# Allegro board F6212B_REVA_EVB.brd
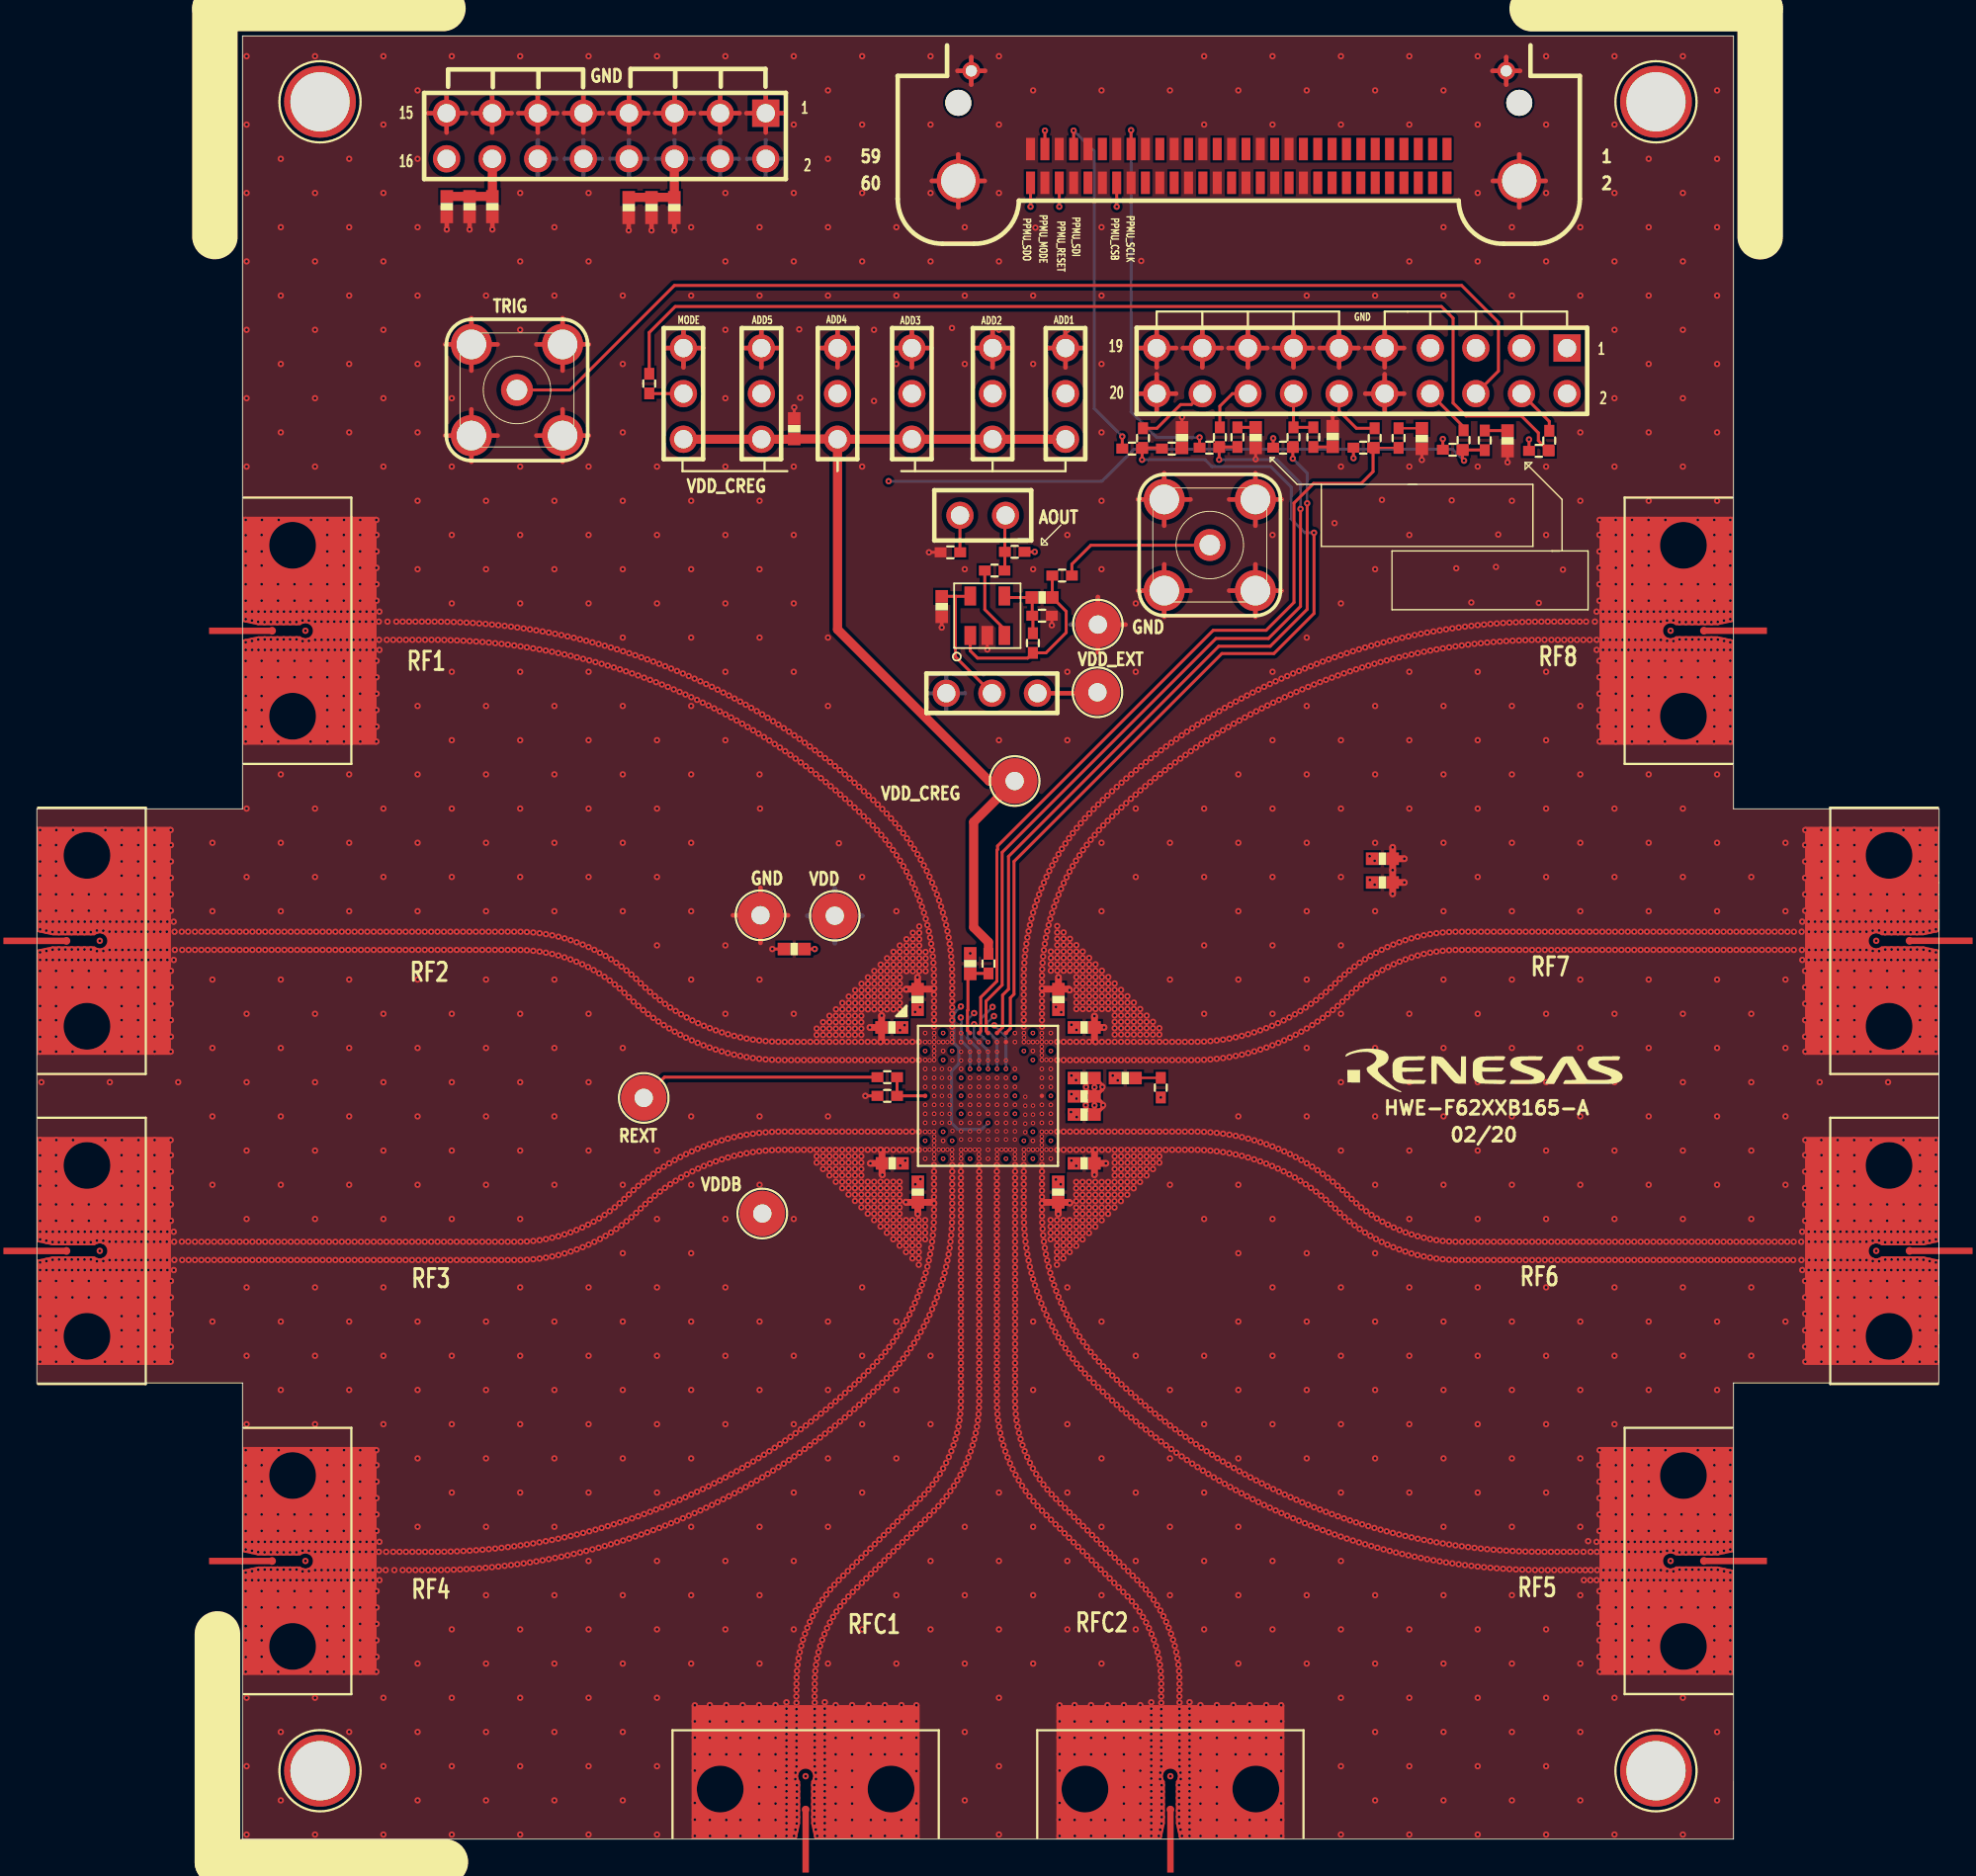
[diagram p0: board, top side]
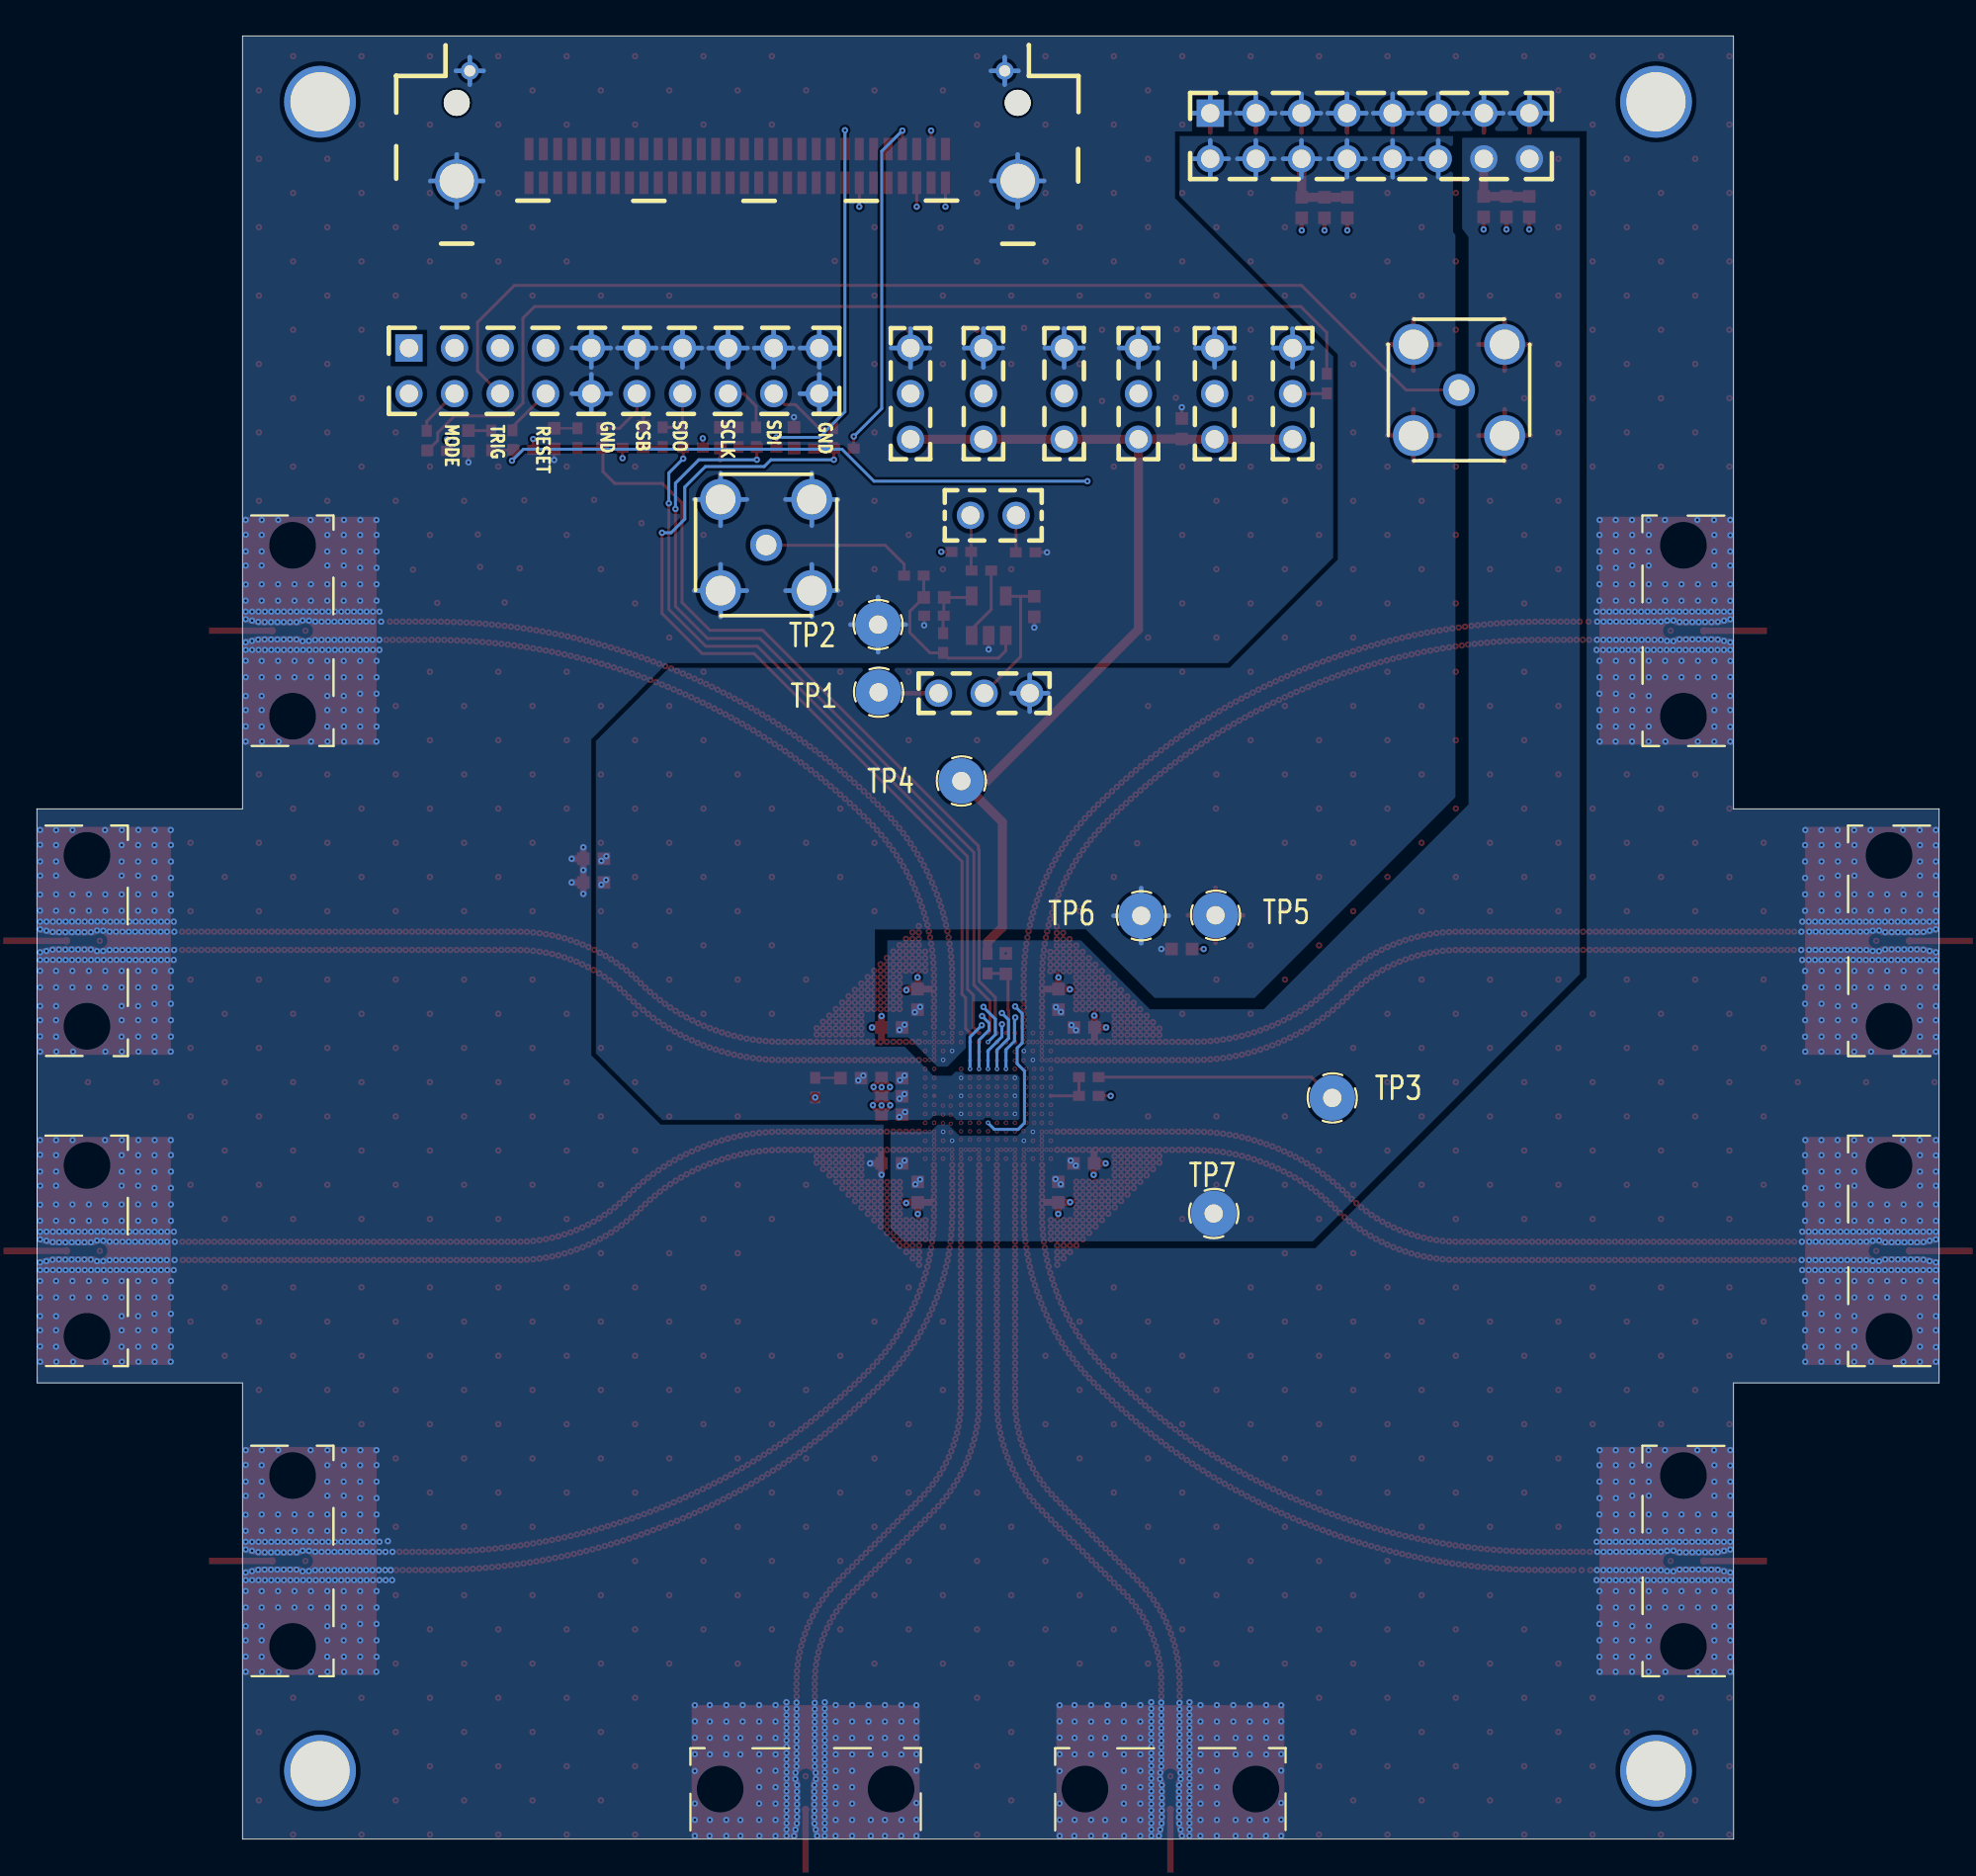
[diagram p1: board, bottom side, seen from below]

Outline 105.97 x 100.44 mm; copper layers: TOP, L2, L3, BOTTOM. Coordinates in mm from the lower left corner of the outline.
Outline path: 0,57.39 11.46,57.39 11.46,100.44 94.51,100.44 94.51,57.39 105.97,57.39 105.95,25.41 94.51,25.41 94.51,0 11.45,0 11.46,25.41 0,25.41 0,57.39

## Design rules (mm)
constraint set DEFAULT: min track width 0.203
net group CREG: nets CREG VDD_CREG
net group N411943: nets N411943 N412142
net group AOUT: nets AOUT N421198 N4197900
net group CSB: nets CSB F2232H_CSB N724495 PPMU_CSB
net group F2232H_MODE: nets F2232H_MODE MODE N417748 PPMU_MODE
net group F2232H_RESET: nets F2232H_RESET N739084 PPMU_RESET RESET
net group F2232H_SCLK: nets F2232H_SCLK N719451 PPMU_SCLK SCLK
net group F2232H_SDI: nets F2232H_SDI N716555 PPMU_SDI SDI
net group N422340: nets N422340 N422374 N4219901
net group PPMU_SDO: nets N485360 N722947 PPMU_SDO SDO
net group RF: nets RF1 RF2 RF3 RF4 RF5 RF6 RF7 RF8
net group VDD: nets N575389

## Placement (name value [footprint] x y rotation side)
C1  10uF  [CAPC1005N]  35.51 90.88 90 top
C3  DNI_C0402  [CAPC1005N]  32.97 90.88 90 top
C4  1uF  [CAPC1005N]  34.24 90.88 90 top
C5  100pF  [CAPC1005N]  58.34 41.38 180 top
C6  100pF  [CAPC1005N]  58.34 42.39 180 top
C7  0.1uF  [CAPC1005N]  42.19 49.58 0 top
C8  1uF  [CAPC1005N]  42.19 78.56 270 top
C9  1uF  [CAPC1005N]  51.99 48.77 90 top
C10  10uF  [CAPC1005N]  50.41 68.66 90 top
C12  DNI_C0402  [CAPC1005N]  81.93 77.89 90 top
C13  DNI_C0402  [CAPC1005N]  55.99 69.16 180 top
C14  DNI_C0402  [CAPC1005N]  77.15 78.02 90 top
C15  DNI_C0402  [CAPC1005N]  67.89 78.07 90 top
C16  DNI_C0402  [CAPC1005N]  63.79 78.07 270 top
C17  DNI_C0402  [CAPC1005N]  72.19 78.13 270 top
C18  0.018uF  [CAPC1005N]  74.96 53.29 180 top
C19  3900pF  [CAPC1005N]  74.96 54.61 180 top
C20  0.068uF  [CAPC1005N]  60.63 42.39 180 top
C21  10uF  [CAPC1005N]  22.83 90.93 90 top
C22  1uF  [CAPC1005N]  24.1 90.93 90 top
C23  DNI_C0402  [CAPC1005N]  25.37 90.93 90 top
C24  100pF  [CAPC1005N]  58.34 40.36 180 top
C25  0.1uF  [CAPC1005N]  58.34 37.64 180 top
C26  0.018uF  [CAPC1005N]  56.9 36.04 90 top
C27  3900pF  [CAPC1005N]  49.07 36.04 90 top
C28  100pF  [CAPC1005N]  47.65 37.64 0 top
C29  0.018uF  [CAPC1005N]  49.06 46.77 270 top
C30  3900pF  [CAPC1005N]  56.91 46.77 270 top
C31  0.1uF  [CAPC1005N]  47.62 45.21 0 top
C32  100pF  [CAPC1005N]  58.34 45.21 180 top
FID1  Fiducial  [FIDUCIAL]  96 101.96 0 top
FID2  Fiducial  [FIDUCIAL]  10.06 -1.27 180 top
FID3  Fiducial  [FIDUCIAL]  9.92 101.97 90 top
J1  ELF40-002 F6212  [ELF40-002_F6121_PIN1_NOANTIPAD]  11.46 67.31 270 top
J2  ELF40-002 F6212  [ELF40-002_F6121_PIN1_NOANTIPAD]  0 50.04 270 top
J3  ELF40-002 F6212  [ELF40-002_F6121_PIN1_NOANTIPAD]  0 32.77 270 top
J4  ELF40-002 F6212  [ELF40-002_F6121_PIN1_NOANTIPAD]  11.46 15.49 270 top
J5  ELF40-002 F6212  [ELF40-002_F6121_PIN1_NOANTIPAD]  42.82 0 0 top
J10  ELF40-002 F6212  [ELF40-002_F6121_PIN1_NOANTIPAD]  63.14 0 0 top
J11  Headerstrip 1X3  [HEADER_1X3_VERTICAL]  57.3 80.52 270 top
J12  Headerstrip 1X3  [HEADER_1X3_VERTICAL]  53.24 80.52 90 top
J13  Headerstrip 1X3  [HEADER_1X3_VERTICAL]  48.74 80.52 90 top
J14  Headerstrip 1X3  [HEADER_1X3_VERTICAL]  44.6 80.52 90 top
J15  Headerstrip 1X3  [HEADER_1X3_VERTICAL]  40.36 80.52 270 top
J16  Headerstrip 2X8  [HEADER_2X8]  29.17 94.87 180 top
J17  ELF40-002 F6212  [ELF40-002_F6121_PIN1_NOANTIPAD]  94.51 15.49 90 top
J18  ELF40-002 F6212  [ELF40-002_F6121_PIN1_NOANTIPAD]  105.97 32.77 90 top
J19  ELF40-002 F6212  [ELF40-002_F6121_PIN1_NOANTIPAD]  105.97 50.04 90 top
J20  ELF40-002 F6212  [ELF40-002_F6121_PIN1_NOANTIPAD]  94.51 67.31 90 top
J21  TE: 1-1337482-0  [SMA_VERT_SNAP_ON-5]  65.34 72.09 0 top
J22  Headerstrip 2X10  [HEADER_2X10]  73.81 81.79 180 top
J26  Headerstrip 1X2  [HEADER_1X2_VERTICAL]  52.69 73.74 180 top
J28  Headerstrip 1X3  [HEADER_1X3_VERTICAL]  36.02 80.52 270 top
J29  Headerstrip 1X3  [HEADER_1X3_VERTICAL]  53.2 63.83 180 top
J30  TE: 1-1337482-0  [SMA_VERT_SNAP_ON-5]  26.75 80.72 0 top
NOREF  -  []  94.51 0 90 top
NOREF#2  -  []  72.54 41.4 0 top
NOREF#3  -  []  105.95 25.41 90 top
NOREF#4  -  []  11.46 100.44 0 top
NOREF#5  -  []  0 57.39 0 top
NOREF#6  -  []  -204.75 -215.7 0 top
R1  DNI_R0402  [RESC1005N]  47.37 41.4 180 top
R2  DNI_R0402  [RESC1005N]  47.37 42.44 180 top
R3  DNI_R0402  [RESC1005N]  34.11 81.08 270 top
R4  0  [RESC1005N]  54.47 71.7 0 top
R5  DNI_R0402  [RESC1005N]  50.89 71.68 0 top
R6  0  [RESC1005N]  55.49 66.62 90 top
R7  DNI_R0402  [RESC1005N]  55.99 68.15 0 top
R9  62  [RESC1005N]  57.11 70.38 180 top
R10  0  [RESC1005N]  79.48 77.93 270 top
R11  DNI_R0402  [RESC1005N]  80.66 77.91 270 top
R12  0  [RESC1005N]  74.52 78.04 270 top
R13  DNI_R0402  [RESC1005N]  75.86 78.04 270 top
R14  0  [RESC1005N]  65.9 78.09 270 top
R15  DNI_R0402  [RESC1005N]  66.88 78.09 270 top
R16  0  [RESC1005N]  61.62 78.04 270 top
R17  DNI_R0402  [RESC1005N]  63.22 77.46 180 top
R18  0  [RESC1005N]  70 78.09 270 top
R19  DNI_R0402  [RESC1005N]  71.11 78.09 90 top
R20  DNI_R0402  [RESC1005N]  53.01 48.77 90 top
R25  0  [RESC1005N]  53.35 70.66 0 top
R26  0  [RESC1005N]  62.61 41.86 90 top
R27  DNI_R0402  [RESC1005N]  61.01 77.46 0 top
R28  DNI_R0402  [RESC1005N]  65.32 77.51 0 top
R29  DNI_R0402  [RESC1005N]  69.42 77.51 0 top
R30  DNI_R0402  [RESC1005N]  73.89 77.51 0 top
R31  DNI_R0402  [RESC1005N]  83.67 77.33 0 top
R32  0  [RESC1005N]  84.25 77.9 270 top
R33  DNI_R0402  [RESC1005N]  78.87 77.39 0 top
SO1  Standoff 25mm  [MH320]  15.77 96.77 0 top
SO2  Standoff 25mm  [MH320]  90.2 96.77 0 top
SO3  Standoff 25mm  [MH320]  15.77 3.81 0 top
SO4  Standoff 25mm  [MH320]  90.2 3.81 0 top
TP1  Loop  [TP254_102]  59.08 63.88 0 top
TP2  Loop  [TP254_102]  59.11 67.65 0 top
TP3  Loop  [TP254_102]  33.81 41.29 0 top
TP4  Loop  [TP254_102]  54.47 58.94 0 top
TP5  Loop  [TP254_102]  40.31 51.46 0 top
TP6  Loop  [TP254_102]  44.45 51.44 0 top
TP7  Loop  [TP254_102]  40.41 34.85 0 top
U2  OPA356  [SOT23-5_TI]  52.95 68.15 0 top
U3  F6212  [BGA165_50P_7X7]  52.98 41.4 0 top
U4  Connector 60P  [SAMTEC_EFR8-60N]  66.95 100.42 0 top

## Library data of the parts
C1 C3-C10 C12-C32 = CAP_1005N: alternate symbols: (CAPC1005L,CAPC1005RF)
FID1-FID3 = Fiducial
J1-J5 J10 J17-J20 = SMA_EDGE_ELF40
J11-J15 J28 J29 = HEADER_1X3
J16 = HEADER_2x8_ALT
J21 J30 = SMA_VERT_SNAPON
J22 = HEADER_2X10
J26 = HEADER_1X2
R1-R7 R9-R20 R25-R33 = RESISTOR_1005N: alternate symbols: (RESC1005RF,RESC1005L,RESC1005M)
SO1-SO4 = Standoff
TP1-TP7 = TESTPOINT
U2 = OPA356
U3 = F6212
U4 = Samtec Female Edge

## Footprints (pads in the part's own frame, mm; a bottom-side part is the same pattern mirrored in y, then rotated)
BGA165_50P_7X7
  round 0.25 smd: A1(-3.5,3.5) A2(-3,3.5) A3(-2.5,3.5) A4(-2,3.5) A5(-1.5,3.5) A6(-1,3.5) A7(-0.5,3.5) A8(0,3.5) A9(0.5,3.5) A10(1,3.5) A11(1.5,3.5) A12(2,3.5) A13(2.5,3.5) A14(3,3.5) A15(3.5,3.5) B1(-3.5,3) B2(-3,3) B3(-2.5,3) B4(-2,3) B5(-1.5,3) B6(-1,3) B7(-0.5,3) B8(0,3) B9(0.5,3) B10(1,3) B11(1.5,3) B12(2,3) B13(2.5,3) B14(3,3) B15(3.5,3) C1(-3.5,2.5) C2(-3,2.5) C3(-2.5,2.5) C4(-2,2.5) C12(2,2.5) C13(2.5,2.5) C14(3,2.5) C15(3.5,2.5) D1(-3.5,2) D2(-3,2) D3(-2.5,2) D13(2.5,2) D14(3,2) D15(3.5,2) E1(-3.5,1.5) E2(-3,1.5) E5(-1.5,1.5) E6(-1,1.5) E7(-0.5,1.5) E8(0,1.5) E9(0.5,1.5) E10(1,1.5) E11(1.5,1.5) E14(3,1.5) E15(3.5,1.5) F1(-3.5,1) F2(-3,1) F5(-1.5,1) F6(-1,1) F7(-0.5,1) F8(0,1) F9(0.5,1) F10(1,1) F11(1.5,1) F14(3,1) F15(3.5,1) G1(-3.5,0.5) G2(-3,0.5) G5(-1.5,0.5) G6(-1,0.5) G7(-0.5,0.5) G8(0,0.5) G9(0.5,0.5) G10(1,0.5) G11(1.5,0.5) G14(3,0.5) G15(3.5,0.5) H1(-3.5,0) H2(-3,0) H5(-1.5,0) H6(-1,0) H7(-0.5,0) H8(0,0) H9(0.5,0) H10(1,0) H11(1.5,0) H14(3,0) H15(3.5,0) J1(-3.5,-0.5) J2(-3,-0.5) J5(-1.5,-0.5) J6(-1,-0.5) J7(-0.5,-0.5) J8(0,-0.5) J9(0.5,-0.5) J10(1,-0.5) J11(1.5,-0.5) J14(3,-0.5) J15(3.5,-0.5) K1(-3.5,-1) K2(-3,-1) K5(-1.5,-1) K6(-1,-1) K7(-0.5,-1) K8(0,-1) K9(0.5,-1) K10(1,-1) K11(1.5,-1) K14(3,-1) K15(3.5,-1) L1(-3.5,-1.5) L2(-3,-1.5) L5(-1.5,-1.5) L6(-1,-1.5) L7(-0.5,-1.5) L8(0,-1.5) L9(0.5,-1.5) L10(1,-1.5) L11(1.5,-1.5) L14(3,-1.5) L15(3.5,-1.5) M1(-3.5,-2) M2(-3,-2) M3(-2.5,-2) M13(2.5,-2) M14(3,-2) M15(3.5,-2) N1(-3.5,-2.5) N2(-3,-2.5) N3(-2.5,-2.5) N4(-2,-2.5) N12(2,-2.5) N13(2.5,-2.5) N14(3,-2.5) N15(3.5,-2.5) P1(-3.5,-3) P2(-3,-3) P3(-2.5,-3) P4(-2,-3) P5(-1.5,-3) P6(-1,-3) P7(-0.5,-3) P8(0,-3) P9(0.5,-3) P10(1,-3) P11(1.5,-3) P12(2,-3) P13(2.5,-3) P14(3,-3) P15(3.5,-3) Q1(-3.5,-3.5) Q2(-3,-3.5) Q3(-2.5,-3.5) Q4(-2,-3.5) Q5(-1.5,-3.5) Q6(-1,-3.5) Q7(-0.5,-3.5) Q8(0,-3.5) Q9(0.5,-3.5) Q10(1,-3.5) Q11(1.5,-3.5) Q12(2,-3.5) Q13(2.5,-3.5) Q14(3,-3.5) Q15(3.5,-3.5)
CAPC1005N
  rect 0.7x0.7 smd: 1(-0.572,0) 2(0.572,0)
ELF40-002_F6121_PIN1_NOANTIPAD
  round 0 hole 2.032 unplated: (-4.76,2.79) (4.76,2.79)
  custom 0.107x0.107 smd: 1(0.002,0)
  rect 0.15x6 smd: 2(3.25,3) 3(-3.25,3)
HEADER_1X2_VERTICAL
  round 1.52 hole 1.02: 1(-1.27,0) 2(1.27,0)
HEADER_1X3_VERTICAL
  round 1.52 hole 1.02: 1(-2.54,0) 2(0,0) 3(2.54,0)
HEADER_2X8
  rect 1.52x1.52 hole 1.02: 1(-11.43,-1.27)
  round 1.52 hole 1.02: 2(-11.43,1.27) 3(-8.89,-1.27) 4(-8.89,1.27) 5(-6.35,-1.27) 6(-6.35,1.27) 7(-3.81,-1.27) 8(-3.81,1.27) 9(-1.27,-1.27) 10(-1.27,1.27) 11(1.27,-1.27) 12(1.27,1.27) 13(3.81,-1.27) 14(3.81,1.27) 15(6.35,-1.27) 16(6.35,1.27)
HEADER_2X10
  rect 1.52x1.52 hole 1.02: 1(-11.43,-1.27)
  round 1.52 hole 1.02: 2(-11.43,1.27) 3(-8.89,-1.27) 4(-8.89,1.27) 5(-6.35,-1.27) 6(-6.35,1.27) 7(-3.81,-1.27) 8(-3.81,1.27) 9(-1.27,-1.27) 10(-1.27,1.27) 11(1.27,-1.27) 12(1.27,1.27) 13(3.81,-1.27) 14(3.81,1.27) 15(6.35,-1.27) 16(6.35,1.27) 17(8.89,-1.27) 18(8.89,1.27) 19(11.43,-1.27) 20(11.43,1.27)
MH320
  round 4 hole 3.3: (0,0)
RESC1005N
  rect 0.66x0.56 smd: 1(-0.546,0) 2(0.546,0)
SAMTEC_EFR8-60N
  round 1.45 hole 1.45 unplated: (-15.625,-3.7) (15.625,-3.7)
  rect 0.5x1.25 smd: 1(11.6,-6.275) 2(11.6,-8.155) 3(10.8,-6.275) 4(10.8,-8.155) 5(10,-6.275) 6(10,-8.155) 7(9.2,-6.275) 8(9.2,-8.155) 9(8.4,-6.275) 10(8.4,-8.155) 11(7.6,-6.275) 12(7.6,-8.155) 13(6.8,-6.275) 14(6.8,-8.155) 15(6,-6.275) 16(6,-8.155) 17(5.2,-6.275) 18(5.2,-8.155) 19(4.4,-6.275) 20(4.4,-8.155) 21(3.6,-6.275) 22(3.6,-8.155) 23(2.8,-6.275) 24(2.8,-8.155) 25(2,-6.275) 26(2,-8.155) 27(1.2,-6.275) 28(1.2,-8.155) 29(0.4,-6.275) 30(0.4,-8.155) 31(-0.4,-6.275) 32(-0.4,-8.155) 33(-1.2,-6.275) 34(-1.2,-8.155) 35(-2,-6.275) 36(-2,-8.155) 37(-2.8,-6.275) 38(-2.8,-8.155) 39(-3.6,-6.275) 40(-3.6,-8.155) 41(-4.4,-6.275) 42(-4.4,-8.155) 43(-5.2,-6.275) 44(-5.2,-8.155) 45(-6,-6.275) 46(-6,-8.155) 47(-6.8,-6.275) 48(-6.8,-8.155) 49(-7.6,-6.275) 50(-7.6,-8.155) 51(-8.4,-6.275) 52(-8.4,-8.155) 53(-9.2,-6.275) 54(-9.2,-8.155) 55(-10,-6.275) 56(-10,-8.155) 57(-10.8,-6.275) 58(-10.8,-8.155) 59(-11.6,-6.275) 60(-11.6,-8.155)
  round 1 hole 0.63: G1(14.9,-1.92) G3(-14.9,-1.92)
  round 2.41 hole 1.91: G2(15.625,-8.05) G4(-15.625,-8.05)
SMA_VERT_SNAP_ON-5
  round 1.778 hole 1.143: 1(0,0)
  round 2.286 hole 1.651: 2(-2.54,2.54) 3(2.54,2.54) 4(2.54,-2.54) 5(-2.54,-2.54)
SOT23-5_TI
  rect 0.65x1.06 smd: 1(-0.95,-1.1) 2(0,-1.1) 3(0.95,-1.1) 4(0.95,1.1) 5(-0.95,1.1)
TP254_102
  round 2.54 hole 1.02: 1(0,0)

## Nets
GND: C1.1 C3.1 C4.1 C5.1 C6.1 C7.1 C8.1 C9.2(\B\) C10.1 C12.1 C14.1 C15.1 C16.1 C17.1 C18.1 C19.1 C21.1 C22.1 C23.1 C24.1 C25.1 C26.1 C27.1 C28.1 C29.1 C30.1 C31.1 C32.1 J1.2 J1.3 J2.2 J2.3 J3.2 J3.3 J4.2 J4.3 J5.2 J5.3 J10.2 J10.3 J11.1 J12.3 J13.3 J14.3 J15.1 J16.1 J16.3 J16.5 J16.7 J16.9 J16.11 J16.13 J16.15 J17.2 J17.3 J18.2 J18.3 J19.2 J19.3 J20.2 J20.3 J21.2 J21.3 J21.4 J21.5 J22.9 J22.10 J22.11 J22.13 J22.15 J22.17 J22.19 J22.20 J28.1 J30.2 J30.3 J30.4 J30.5 R1.2 R5.1 R7.2 R26.1 TP2.1 TP5.1 U2.2(\V-\) U3.A1 U3.A2 U3.A4 U3.A5 U3.A11 U3.A12 U3.A14 U3.A15 U3.B1 U3.B2 U3.B3 U3.B4 U3.B5 U3.B6 U3.B7 U3.B9 U3.B10 U3.B11 U3.B12 U3.B13 U3.B14 U3.B15 U3.C2 U3.C3 U3.C13 U3.C14 U3.D1 U3.D2 U3.D14 U3.D15 U3.E1 U3.E2 U3.E5 U3.E11 U3.E14 U3.E15 U3.F1 U3.F2 U3.F6 U3.F7 U3.F8 U3.F9 U3.F10 U3.F14 U3.F15 U3.G1 U3.G2 U3.G5 U3.G6 U3.G7 U3.G8 U3.G9 U3.G10 U3.G11 U3.G14 U3.G15 U3.H2 U3.H6 U3.H7 U3.H8 U3.H9 U3.H10 U3.H14 U3.J1 U3.J2 U3.J5 U3.J6 U3.J7 U3.J8 U3.J9 U3.J10 U3.J11 U3.J14 U3.J15 U3.K1 U3.K2 U3.K6 U3.K7 U3.K8 U3.K9 U3.K10 U3.K14 U3.K15 U3.L1 U3.L2 U3.L5 U3.L6 U3.L7 U3.L9 U3.L10 U3.L11 U3.L14 U3.L15 U3.M1 U3.M2 U3.M14 U3.M15 U3.N2 U3.N3 U3.N13 U3.N14 U3.P1 U3.P2 U3.P3 U3.P4 U3.P5 U3.P6 U3.P7 U3.P8 U3.P9 U3.P10 U3.P11 U3.P12 U3.P13 U3.P14 U3.P15 U3.Q1 U3.Q2 U3.Q4 U3.Q5 U3.Q7 U3.Q8 U3.Q9 U3.Q11 U3.Q12 U3.Q14 U3.Q15 U4.22 U4.23 U4.26 U4.27 U4.30 U4.31 U4.34 U4.35 U4.38 U4.39 U4.42 U4.43 U4.46 U4.47 U4.50 U4.51 U4.54 U4.55 U4.58 U4.59 U4.G1 U4.G2 U4.G3 U4.G4
VDD: C1.2(\B\) C3.2(\B\) C4.2(\B\) C5.2(\B\) C6.2(\B\) C7.2(\B\) C18.2(\B\) C19.2(\B\) C20.2(\B\) C24.2(\B\) J16.2 J16.4 J16.6 J16.8 J16.10 J16.12 J29.3 TP6.1 U3.F5 U3.F11 U3.H5 U3.H11 U3.K5(\VDD_K5\) U3.K11
VDD_CREG: C8.2(\B\) J11.3 J12.1 J13.1 J14.1 J15.3 J28.3 R20.2 TP4.1
VDD_EXT: J29.1 TP1.1
VDDB: C21.2(\B\) C22.2(\B\) C23.2(\B\) C25.2(\B\) C26.2(\B\) C27.2(\B\) C28.2(\B\) C29.2(\B\) C30.2(\B\) C31.2(\B\) C32.2(\B\) J16.14 J16.16 TP7.1 U3.C4 U3.C12 U3.D3 U3.D13 U3.M3 U3.M13 U3.N4 U3.N12
ADD1: J11.2 U3.E10
ADD2: J12.2 U3.E9
ADD3: J13.2 U3.E8
ADD4: J14.2 U3.E7
ADD5: J15.2 U3.E6
AOUT: R4.2 U3.H15
CREG: C9.1 R20.1 U3.A6
CSB: R12.2 R13.2 R30.2 U3.A7
F2232H_CSB: J22.12 R12.1
F2232H_MODE: J22.4 R32.1
F2232H_RESET: J22.8 R10.1
F2232H_SCLK: J22.16 R14.1
F2232H_SDI: J22.18 R16.1
MODE: R3.1 R31.2 R32.2
PPMU_CSB: R30.1 U4.48
PPMU_MODE: R31.1 U4.57
PPMU_RESET: R33.1 U4.56
PPMU_SCLK: R28.1 U4.45
PPMU_SDI: R27.1 U4.53
PPMU_SDO: R29.1 U4.60
RESET: R10.2 R11.2 R33.2 U3.B8
RF1: J1.1 U3.A3
RF2: J2.1 U3.C1
RF3: J3.1 U3.N1
RF4: J4.1 U3.Q3
RF5: J17.1 U3.Q13
RF6: J18.1 U3.N15
RF7: J19.1 U3.C15
RF8: J20.1 U3.A13
RFC1: J5.1 U3.Q6
RFC2: J10.1 U3.Q10
SCLK: R14.2 R15.2 R28.2 U3.A8
SDI: R16.2 R17.2 R27.2 U3.A10
SDO: R18.2 R29.2 U3.A9
TRIG: J22.6 J30.1(\S1\)
N411943: R1.1 R2.1 U3.H1
N412142: R2.2 TP3.1
N417748: J28.2 R3.2 U3.L8
N421198: J26.1 R4.1 R25.2
N421279: J26.2 R5.2
N422340: C13.2(\B\) R6.2 R7.1 U2.4
N422374: C13.1 R6.1 R9.2 U2.1
N464793: C10.2(\B\) J29.2 U2.5
N485360: J22.14 R18.1 R19.2
N575389: C20.1 R26.2
N716555: C16.2(\B\) R17.1
N719451: C15.2(\B\) R15.1
N722947: C17.2(\B\) R19.1
N724495: C14.2(\B\) R13.1
N739084: C12.2(\B\) R11.1
N4197900: R25.1 U2.3
N4219901: J21.1(\S1\) R9.1

Pads without a net: J22 1 2 3 5 7; U4 1 2 3 4 5 6 7 8 9 10 11 12 13 14 15 16 17 18 19 20 21 24 25 28 29 32 33 36 37 40 41 44 49 52

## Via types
v1: diameter 0.356, hole 0.152, TOP to BOTTOM, 1868 vias
v2: diameter 0.25, hole 0.13, TOP to BOTTOM, 21 vias
v3: diameter 0.25, hole 0.13, TOP to L2, 11 vias
v4: diameter 0.356, hole 0.152, TOP to L2, 10 vias
v5: diameter 0.356, hole 0.152, TOP to L3, 3542 vias
v6: diameter 0.25, hole 0.13, TOP to L3, 214 vias

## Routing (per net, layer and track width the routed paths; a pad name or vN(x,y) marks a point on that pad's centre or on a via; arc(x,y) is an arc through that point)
GND: length 680.7
  TOP w0.127: U3.G14 v6(55.98,41.9) ; U3.M2 v6(49.98,39.41)
  TOP w0.165: C16.1 v1(63.79,79.21) ; v1(59.4,40.88) 59.4,40.96 ; C15.1 v5(67.89,76.86) ; C7.1 v1(40.97,49.58) ; R1.2 v1(46.15,41.4) ; C8.1 v1(42.19,79.76) ; C14.1 v1(77.15,76.82) ; v1(47.07,45.87) 47.07,45.22 C31.1 ; R5.1 v1(49.7,71.68) ; C12.1 v1(81.93,76.7) ; R7.2 v1(56.54,67.61) ; v1(59.36,41.9) 59.36,42.01 58.98,42.39 C6.1 58.85,42.39 58.45,41.99 v1(58.45,41.9) ; C24.1 v1(58.92,40.87) ; U2.2 v1(52.95,66.27)
  TOP w0.203: C10.1 v1(50.41,67.49) ; v1(58.45,41.9) 58.45,41.78 58.85,41.38 ; v1(59.4,40.88) 59.4,40.78 58.98,40.36 C24.1 58.85,40.36 58.43,40.78 v1(58.43,40.88) 58.43,40.96 58.85,41.38 ; 58.85,41.38 C5.1 ; 59.4,40.96 58.98,41.38 ; 58.98,41.38 C5.1 ; 58.98,41.38 59.36,41.76 v1(59.36,41.9) ; C5.1 v1(58.92,41.88) C6.1 ; C5.1 v1(58.92,40.87) ; C17.1 v5(72.19,79.35)
  TOP w0.254: 66.38,83.06 J22.15 ; J22.15 67.46,84.14 ; J22.15 67.46,81.98 ; J22.15 68.54,83.06 ; J22.20 63.46,80.52 ; J22.20 62.38,79.44 ; J22.20 61.3,80.52 ; J22.20 62.38,81.6 ; J16.5 35.52,97.22 ; J16.5 36.6,96.14 ; J16.5 34.44,96.14 ; J16.5 35.52,95.06 ; 24.28,96.14 J16.13 ; J16.13 25.36,95.06 ; J16.13 25.36,97.22 ; J16.13 26.44,96.14 ; 62.8,68.08 J21.5 ; J21.5 62.8,71.01 ; J21.5 64.26,69.55 ; J21.5 61.34,69.55 ; U4.G4 51.33,93.84 ; U4.G4 49.86,92.37 ; U4.G4 51.33,90.89 ; U4.G4 52.8,92.37 ; J16.3 38.06,97.22 ; J16.3 39.14,96.14 ; J16.3 36.98,96.14 ; J16.3 38.06,95.06 ; 66.42,69.55 J21.4 ; J21.4 67.88,68.08 ; J21.4 67.88,71.01 ; J21.4 69.34,69.55 ; 34.94,83.06 J28.1 ; J28.1 37.1,83.06 ; J28.1 36.02,84.14 ; J28.1 36.02,81.98 ; 40.36,81.98 J15.1 ; J15.1 40.36,84.14 ; J15.1 39.28,83.06 ; J15.1 41.44,83.06 ; J30.5 25.67,78.18 ; J30.5 24.21,79.64 ; J30.5 24.21,76.72 ; J30.5 22.75,78.18 ; J16.1 40.6,97.22 ; J16.1 39.52,96.14 ; J16.1 40.6,95.06 ; J16.1 41.68,96.14 ; TP2.1 60.64,67.65 ; TP2.1 59.11,66.12 ; TP2.1 59.11,69.19 ; C3.1 v1(32.97,89.61) ; J22.13 71.08,83.06 ; J22.13 68.92,83.06 ; J22.13 70,81.98 ; J22.13 70,84.14 ; J22.11 73.62,83.06 ; J22.11 71.46,83.06 ; J22.11 72.54,84.14 ; J22.11 72.54,81.98 ; 44.6,81.98 J14.3 ; J14.3 44.6,84.14 ; J14.3 43.52,83.06 ; J14.3 45.68,83.06 ; J22.9 76.16,83.06 ; J22.9 75.08,84.14 ; J22.9 75.08,81.98 ; J22.9 74,83.06 ; U4.G1 82.62,98.5 ; U4.G1 81.09,98.5 ; U4.G1 81.85,97.73 ; U4.G1 81.85,99.26 ; C21.1 v1(22.83,89.66) ; 52.16,83.06 J12.3 ; J12.3 53.24,81.98 ; J12.3 54.32,83.06 ; J12.3 53.24,84.14 ; 64.92,81.98 J22.17 ; J22.17 64.92,84.14 ; J22.17 66,83.06 ; J22.17 63.84,83.06 ; J16.9 30.44,97.22 ; J16.9 31.52,96.14 ; J16.9 29.36,96.14 ; J16.9 30.44,95.06 ; 38.77,51.46 TP5.1 ; TP5.1 41.85,51.46 ; TP5.1 40.31,53 ; TP5.1 40.31,49.92 ; 32.98,95.06 J16.7 ; J16.7 31.9,96.14 ; J16.7 32.98,97.22 ; J16.7 34.06,96.14 ; 56.22,83.06 J11.1 ; J11.1 58.38,83.06 ; J11.1 57.3,81.98 ; J11.1 57.3,84.14 ; U4.G2 82.58,93.84 ; U4.G2 81.11,92.37 ; U4.G2 82.58,90.89 ; U4.G2 84.05,92.37 ; J21.3 67.88,76.09 ; J21.3 66.42,74.63 ; J21.3 67.88,73.16 ; J21.3 69.34,74.63 ; J16.11 27.9,97.22 ; J16.11 28.98,96.14 ; J16.11 26.82,96.14 ; J16.11 27.9,95.06 ; C22.1 v1(24.1,89.66) ; J30.2 24.21,84.72 ; J30.2 24.21,81.8 ; J30.2 22.75,83.26 ; J30.2 25.67,83.26 ; J30.3 29.29,84.72 ; J30.3 30.75,83.26 ; J30.3 29.29,81.8 ; J30.3 27.83,83.26 ; U4.G3 52.82,98.5 ; U4.G3 51.29,98.5 ; U4.G3 52.05,99.26 ; U4.G3 52.05,97.73 ; J30.4 30.75,78.18 ; J30.4 29.29,79.64 ; J30.4 27.83,78.18 ; J30.4 29.29,76.72 ; J22.19 63.46,83.06 ; J22.19 62.38,84.14 ; J22.19 62.38,81.98 ; J22.19 61.3,83.06 ; 48.74,81.98 J13.3 ; J13.3 49.82,83.06 ; J13.3 47.66,83.06 ; J13.3 48.74,84.14 ; 75.08,79.44 J22.10 ; J22.10 74,80.52 ; J22.10 75.08,81.6 ; J22.10 76.16,80.52 ; C4.1 v1(34.24,89.61) ; 62.8,73.16 J21.2 ; J21.2 64.26,74.63 ; J21.2 62.8,76.09 ; J21.2 61.34,74.63 ; 22.82,95.06 J16.15 ; J16.15 23.9,96.14 ; J16.15 21.74,96.14 ; J16.15 22.82,97.22 ; C1.1 v1(35.51,89.61) ; C23.1 v1(25.37,89.66)
  TOP w0.381: C29.1 48.44,47.35 v1(48.42,47.33) ; C29.1 49.93,47.35 v5(49.98,47.39) ; C29.1 v1(49.06,48.01) ; C25.1 v1(59.55,37.64) ; C25.1 58.92,38.34 v5(58.97,38.39) ; C25.1 v1(58.92,37.01) ; C28.1 v1(46.43,37.64) ; C28.1 47.08,37.03 v1(47.1,37) ; C28.1 47.08,38.31 v5(47,38.39) ; v1(57.54,35.43) 57.51,35.47 C26.1 ; v5(47,44.41) 47.05,44.47 C31.1 ; C18.1 v1(76.17,53.29) ; C18.1 v1(75.53,53.98) C19.1 ; C18.1 v1(75.53,52.65) ; C19.1 v1(75.53,55.25) ; C19.1 v1(76.17,54.61) ; C32.1 v1(58.92,45.85) ; C32.1 58.92,44.47 v5(58.97,44.41) ; C32.1 v1(59.45,45.21) ; C30.1 v1(56.91,48.01) ; C30.1 56.04,47.35 v5(55.99,47.39) ; C30.1 57.48,47.35 v1(57.53,47.29) ; v1(47.07,45.87) 47.05,45.86 C31.1 ; v5(55.99,35.41) 56.05,35.47 C26.1 ; C27.1 49.92,35.47 v5(49.98,35.41) ; C27.1 48.43,35.47 v1(48.41,35.48) ; C27.1 v1(49.07,34.82) ; C31.1 v1(46.41,45.21) ; C26.1 v1(56.9,34.82)
  L2 w0.254: 75.08,81.98 J22.9 ; J22.9 75.08,84.14 ; J22.9 74,83.06 ; J22.9 76.16,83.06 ; J21.5 62.8,71.01 ; J21.5 62.8,68.08 ; J21.5 64.26,69.55 ; J21.5 61.34,69.55 ; J16.11 28.98,96.14 ; J16.11 27.9,95.06 ; J16.11 27.9,97.22 ; J16.11 26.82,96.14 ; J16.3 39.14,96.14 ; J16.3 38.06,95.06 ; J16.3 36.98,96.14 ; J16.3 38.06,97.22 ; J16.5 36.6,96.14 ; J16.5 35.52,95.06 ; J16.5 35.52,97.22 ; J16.5 34.44,96.14 ; 24.28,96.14 J16.13 ; J16.13 25.36,97.22 ; J16.13 25.36,95.06 ; J16.13 26.44,96.14 ; 62.38,81.98 J22.19 ; J22.19 63.46,83.06 ; J22.19 62.38,84.14 ; J22.19 61.3,83.06 ; 52.16,83.06 J12.3 ; J12.3 53.24,84.14 ; J12.3 53.24,81.98 ; J12.3 54.32,83.06 ; 39.28,83.06 J15.1 ; J15.1 40.36,84.14 ; J15.1 41.44,83.06 ; J15.1 40.36,81.98 ; 81.09,98.5 U4.G1 ; U4.G1 82.62,98.5 ; U4.G1 81.85,99.26 ; U4.G1 81.85,97.73 ; J28.1 36.02,84.14 ; J28.1 36.02,81.98 ; J28.1 34.94,83.06 ; J28.1 37.1,83.06 ; TP2.1 60.37,67.65 ; TP2.1 57.84,67.65 ; TP2.1 59.11,68.92 ; TP2.1 59.11,66.39 ; J22.20 62.38,81.6 ; J22.20 62.38,79.44 ; J22.20 63.46,80.52 ; J22.20 61.3,80.52 ; J30.4 30.75,78.18 ; J30.4 29.29,76.72 ; J30.4 27.83,78.18 ; J30.4 29.29,79.64 ; J11.1 57.3,84.14 ; J11.1 58.38,83.06 ; J11.1 56.22,83.06 ; J11.1 57.3,81.98 ; 75.08,79.44 J22.10 ; J22.10 76.16,80.52 ; J22.10 74,80.52 ; J22.10 75.08,81.6 ; 48.74,81.98 J13.3 ; J13.3 49.82,83.06 ; J13.3 48.74,84.14 ; J13.3 47.66,83.06 ; 51.33,90.89 U4.G4 ; U4.G4 49.86,92.37 ; U4.G4 52.8,92.37 ; U4.G4 51.33,93.84 ; 61.34,74.63 J21.2 ; J21.2 64.26,74.63 ; J21.2 62.8,73.16 ; J21.2 62.8,76.09 ; J16.9 31.52,96.14 ; J16.9 30.44,95.06 ; J16.9 29.36,96.14 ; J16.9 30.44,97.22 ; U4.G2 82.58,93.84 ; U4.G2 81.11,92.37 ; U4.G2 82.58,90.89 ; U4.G2 84.05,92.37 ; 22.75,83.26 J30.2 ; J30.2 25.67,83.26 ; J30.2 24.21,81.8 ; J30.2 24.21,84.72 ; J22.11 72.54,84.14 ; J22.11 72.54,81.98 ; J22.11 73.62,83.06 ; 24.21,76.72 J30.5 ; J30.5 22.75,78.18 ; J30.5 25.67,78.18 ; J30.5 24.21,79.64 ; 32.98,95.06 J16.7 ; J16.7 31.9,96.14 ; J16.7 32.98,97.22 ; J16.7 34.06,96.14 ; 67.88,73.16 J21.3 ; J21.3 67.88,76.09 ; J21.3 66.42,74.63 ; J21.3 69.34,74.63 ; 70,84.14 J22.13 70,81.98 ; J16.1 41.68,96.14 ; J16.1 40.6,97.22 ; J16.1 39.52,96.14 ; J16.1 40.6,95.06 ; 67.88,68.08 J21.4 ; J21.4 67.88,71.01 ; J21.4 66.42,69.55 ; J21.4 69.34,69.55 ; 66.38,83.06 J22.15 ; J22.15 67.46,84.14 ; J22.15 67.46,81.98 ; 39.04,51.46 TP5.1 ; TP5.1 40.31,50.19 ; TP5.1 40.31,52.73 ; TP5.1 41.58,51.46 ; J16.15 22.82,97.22 ; J16.15 23.9,96.14 ; J16.15 21.74,96.14 ; J16.15 22.82,95.06 ; 63.84,83.06 J22.17 ; J22.17 64.92,81.98 ; J22.17 66,83.06 ; J22.17 64.92,84.14 ; U4.G3 52.05,99.26 ; U4.G3 52.05,97.73 ; U4.G3 51.29,98.5 ; U4.G3 52.82,98.5 ; J14.3 45.68,83.06 ; J14.3 43.52,83.06 ; J14.3 44.6,81.98 ; J14.3 44.6,84.14 ; J30.3 30.75,83.26 ; J30.3 29.29,84.72 ; J30.3 29.29,81.8 ; J30.3 27.83,83.26
  L3 w0.254: 32.98,95.06 J16.7 ; J16.7 32.98,97.22 ; J16.7 31.9,96.14 ; J16.7 34.06,96.14 ; 62.38,79.44 J22.20 ; J22.20 61.3,80.52 ; J22.20 62.38,81.6 ; J22.20 63.46,80.52 ; J16.5 35.52,97.22 ; J16.5 36.6,96.14 ; J16.5 35.52,95.06 ; J16.5 34.44,96.14 ; 39.52,96.14 J16.1 ; J16.1 40.6,97.22 ; J16.1 41.68,96.14 ; J16.1 40.6,95.06 ; J30.2 24.21,84.72 ; J30.2 24.21,81.8 ; J30.2 22.75,83.26 ; J30.2 25.67,83.26 ; J11.1 58.38,83.06 ; J11.1 57.3,81.98 ; J11.1 56.22,83.06 ; J11.1 57.3,84.14 ; 38.06,95.06 J16.3 ; J16.3 39.14,96.14 ; J16.3 38.06,97.22 ; J16.3 36.98,96.14 ; 71.46,83.06 J22.11 ; J22.11 72.54,84.14 ; J22.11 73.62,83.06 ; J22.11 72.54,81.98 ; 53.24,81.98 J12.3 ; J12.3 52.16,83.06 ; J12.3 53.24,84.14 ; J12.3 54.32,83.06 ; J30.4 30.75,78.18 ; J30.4 29.29,76.72 ; J30.4 27.83,78.18 ; J30.4 29.29,79.64 ; 51.33,90.89 U4.G4 ; U4.G4 52.8,92.37 ; U4.G4 49.86,92.37 ; U4.G4 51.33,93.84 ; 67.88,68.08 J21.4 ; J21.4 67.88,71.01 ; J21.4 69.34,69.55 ; J21.4 66.42,69.55 ; 25.36,95.06 J16.13 ; J16.13 24.28,96.14 ; J16.13 25.36,97.22 ; J16.13 26.44,96.14 ; U4.G3 52.05,99.26 ; U4.G3 52.82,98.5 ; U4.G3 51.29,98.5 ; U4.G3 52.05,97.73 ; 64.92,81.98 J22.17 ; J22.17 63.84,83.06 ; J22.17 64.92,84.14 ; J22.17 66,83.06 ; TP5.1 40.31,52.73 ; TP5.1 40.31,50.19 ; TP5.1 39.04,51.46 ; TP5.1 41.58,51.46 ; J16.15 22.82,97.22 ; J16.15 22.82,95.06 ; J16.15 21.74,96.14 ; J16.15 23.9,96.14 ; J15.1 40.36,84.14 ; J15.1 39.28,83.06 ; J15.1 41.44,83.06 ; J15.1 40.36,81.98 ; 26.82,96.14 J16.11 ; J16.11 27.9,95.06 ; J16.11 27.9,97.22 ; J16.11 28.98,96.14 ; 75.08,79.44 J22.10 ; J22.10 75.08,81.6 ; J22.10 76.16,80.52 ; J22.10 74,80.52 ; 67.88,73.16 J21.3 ; J21.3 69.34,74.63 ; J21.3 67.88,76.09 ; J21.3 66.42,74.63 ; J13.3 49.82,83.06 ; J13.3 47.66,83.06 ; J13.3 48.74,84.14 ; J13.3 48.74,81.98 ; J30.3 30.75,83.26 ; J30.3 27.83,83.26 ; J30.3 29.29,81.8 ; J30.3 29.29,84.72 ; J22.9 76.16,83.06 ; J22.9 75.08,81.98 ; J22.9 74,83.06 ; J22.9 75.08,84.14 ; J22.15 67.46,84.14 ; J22.15 66.38,83.06 ; J22.15 68.54,83.06 ; J22.15 67.46,81.98 ; J30.5 25.67,78.18 ; J30.5 24.21,79.64 ; J30.5 22.75,78.18 ; J30.5 24.21,76.72 ; 62.8,73.16 J21.2 ; J21.2 61.34,74.63 ; J21.2 64.26,74.63 ; J21.2 62.8,76.09 ; J22.19 63.46,83.06 ; J22.19 61.3,83.06 ; J22.19 62.38,81.98 ; J22.19 62.38,84.14 ; J22.13 70,84.14 ; J22.13 71.08,83.06 ; J22.13 68.92,83.06 ; J22.13 70,81.98 ; J16.9 30.44,97.22 ; J16.9 29.36,96.14 ; J16.9 30.44,95.06 ; J16.9 31.52,96.14 ; J28.1 37.1,83.06 ; J28.1 36.02,84.14 ; J28.1 34.94,83.06 ; J28.1 36.02,81.98 ; 81.11,92.37 U4.G2 ; U4.G2 82.58,90.89 ; U4.G2 82.58,93.84 ; U4.G2 84.05,92.37 ; U4.G1 82.62,98.5 ; U4.G1 81.85,97.73 ; U4.G1 81.85,99.26 ; U4.G1 81.09,98.5 ; J14.3 44.6,84.14 ; J14.3 43.52,83.06 ; J14.3 44.6,81.98 ; J14.3 45.68,83.06 ; J21.5 62.8,71.01 ; J21.5 61.34,69.55 ; J21.5 62.8,68.08 ; J21.5 64.26,69.55 ; TP2.1 60.37,67.65 ; TP2.1 59.11,66.39 ; TP2.1 57.84,67.65 ; TP2.1 59.11,68.92
  BOTTOM w0.254: 53.24,81.98 J12.3 ; J12.3 52.16,83.06 ; J12.3 54.32,83.06 ; J12.3 53.24,84.14 ; 81.09,98.5 U4.G1 ; U4.G1 82.62,98.5 ; U4.G1 81.85,99.26 ; U4.G1 81.85,97.73 ; J16.1 41.68,96.14 ; J16.1 40.6,97.22 ; J16.1 39.52,96.14 ; J16.11 27.9,97.22 ; J16.11 26.82,96.14 ; J16.11 28.98,96.14 ; J22.17 64.92,84.14 ; J22.17 64.92,81.98 ; J22.17 66,83.06 ; J22.17 63.84,83.06 ; 59.11,66.12 TP2.1 ; TP2.1 57.57,67.65 ; TP2.1 59.11,69.19 ; TP2.1 60.64,67.65 ; J28.1 37.1,83.06 ; J28.1 34.94,83.06 ; J28.1 36.02,84.14 ; J28.1 36.02,81.98 ; J16.5 35.52,97.22 ; J16.5 36.6,96.14 ; J16.5 34.44,96.14 ; J21.3 67.88,76.09 ; J21.3 67.88,73.16 ; J21.3 69.34,74.63 ; J21.3 66.42,74.63 ; 56.22,83.06 J11.1 ; J11.1 58.38,83.06 ; J11.1 57.3,84.14 ; J11.1 57.3,81.98 ; 81.11,92.37 U4.G2 ; U4.G2 82.58,93.84 ; U4.G2 84.05,92.37 ; U4.G2 82.58,90.89 ; J13.3 48.74,84.14 ; J13.3 48.74,81.98 ; J13.3 47.66,83.06 ; J13.3 49.82,83.06 ; J22.10 76.16,80.52 ; J22.10 75.08,79.44 ; J22.10 75.08,81.6 ; J22.10 74,80.52 ; 29.36,96.14 J16.9 ; J16.9 31.52,96.14 ; J16.9 30.44,97.22 ; 49.86,92.37 U4.G4 ; U4.G4 51.33,90.89 ; U4.G4 51.33,93.84 ; U4.G4 52.8,92.37 ; J16.15 23.9,96.14 ; J16.15 21.74,96.14 ; J16.15 22.82,97.22 ; J21.5 62.8,71.01 ; J21.5 64.26,69.55 ; J21.5 62.8,68.08 ; J21.5 61.34,69.55 ; J22.9 76.16,83.06 ; J22.9 75.08,81.98 ; J22.9 74,83.06 ; J22.9 75.08,84.14 ; 71.46,83.06 J22.11 ; J22.11 73.62,83.06 ; J22.11 72.54,81.98 ; J22.11 72.54,84.14 ; 36.98,96.14 J16.3 ; J16.3 39.14,96.14 ; J16.3 38.06,97.22 ; J21.4 67.88,71.01 ; J21.4 67.88,68.08 ; J21.4 69.34,69.55 ; J21.4 66.42,69.55 ; J22.15 67.46,84.14 ; J22.15 68.54,83.06 ; J22.15 67.46,81.98 ; J22.15 66.38,83.06 ; J21.2 64.26,74.63 ; J21.2 61.34,74.63 ; J21.2 62.8,76.09 ; J21.2 62.8,73.16 ; J22.20 62.38,81.6 ; J22.20 62.38,79.44 ; J22.20 63.46,80.52 ; J22.20 61.3,80.52 ; J14.3 45.68,83.06 ; J14.3 44.6,84.14 ; J14.3 44.6,81.98 ; J14.3 43.52,83.06 ; 70,81.98 J22.13 ; J22.13 68.92,83.06 ; J22.13 70,84.14 ; J22.13 71.08,83.06 ; 40.36,81.98 J15.1 ; J15.1 41.44,83.06 ; J15.1 40.36,84.14 ; J15.1 39.28,83.06 ; 51.29,98.5 U4.G3 ; U4.G3 52.05,97.73 ; U4.G3 52.82,98.5 ; U4.G3 52.05,99.26 ; J16.13 25.36,97.22 ; J16.13 26.44,96.14 ; J16.13 24.28,96.14 ; J16.7 32.98,97.22 ; J16.7 34.06,96.14 ; J16.7 31.9,96.14 ; 62.38,81.98 J22.19 ; J22.19 63.46,83.06 ; J22.19 62.38,84.14 ; J22.19 61.3,83.06
  vias: v1(0.18,56.21) v1(0.18,55.36) v1(0.18,54.46) v1(0.18,53.67) v1(0.18,52.63) v1(0.18,51.71) v1(0.18,51.1) v1(0.18,50.68) v1(0.18,49.4) v1(0.18,48.97) v1(0.18,48.36) v1(0.18,47.46) v1(0.18,46.41) v1(0.18,45.62) v1(0.18,44.69) v1(0.18,43.87) v1(0.18,38.94) v1(0.18,38.09) v1(0.18,37.19) v1(0.18,36.4) v1(0.18,35.35) v1(0.18,34.44) v1(0.18,33.83) v1(0.18,33.41) v1(0.18,32.12) v1(0.18,31.7) v1(0.18,31.09) v1(0.18,30.19) v1(0.18,29.14) v1(0.18,28.35) v1(0.18,27.41) v1(0.18,26.59) v1(0.53,51.1) v1(0.53,50.61) v1(0.53,49.47) v1(0.53,48.97) v1(0.53,33.83) v1(0.53,33.33) v1(0.53,32.2) v1(0.53,31.7) v1(0.89,51.1) v1(0.87,50.53) v1(0.88,49.54) v1(0.89,48.97) v1(0.89,33.83) v1(0.87,33.26) v1(0.88,32.27) v1(0.89,31.7) v1(1.08,56.21) v1(1.07,55.37) v1(1.07,54.46) v1(1.07,53.67) v1(1.07,52.63) v1(1.07,51.71) v1(1.07,48.36) v1(1.07,47.45) v1(1.06,46.4) v1(1.07,45.62) v1(1.07,44.7) v1(1.07,43.87) v1(1.08,38.94) v1(1.07,38.1) v1(1.07,37.18) v1(1.07,36.4) v1(1.07,35.36) v1(1.07,34.44) v1(1.07,31.09) v1(1.07,30.18) v1(1.06,29.13) v1(1.07,28.35) v1(1.07,27.43) v1(1.07,26.59) v1(1.23,50.52) v1(1.23,33.25) v1(1.25,51.1) v1(1.23,49.56) v1(1.25,48.97) v1(1.25,33.83) v1(1.23,32.28) v1(1.25,31.7) v1(1.6,51.1) v1(1.58,50.53) v1(1.59,49.56) v1(1.6,48.97) v1(1.6,33.83) v1(1.58,33.25) v1(1.59,32.28) v1(1.6,31.7) v1(2.01,56.21) v1(1.98,52.63) v1(1.98,51.71) v1(1.95,51.1) v1(1.94,50.52) v1(1.94,49.56) v1(1.96,48.97) v1(1.98,48.36) v1(1.98,47.45) v1(1.99,43.87) v1(2.01,38.94) v1(1.98,35.36) v1(1.98,34.44) v1(1.95,33.83) v1(1.94,33.25) v1(1.94,32.28) v1(1.96,31.7) v1(1.98,31.09) v1(1.98,30.18) v1(1.99,26.59) v1(2.31,51.1) v1(2.3,50.52) v1(2.3,49.56) v1(2.31,48.97) v1(2.31,33.83) v1(2.3,33.25) v1(2.3,32.28) v1(2.31,31.7) v1(2.66,51.1) v1(2.65,50.52) v1(2.65,49.56) v1(2.67,48.97) v1(2.66,33.83) v1(2.65,33.25) v1(2.65,32.28) v1(2.67,31.7) v1(2.89,52.63) v1(2.9,51.71) v1(2.89,48.36) v1(2.9,47.45) v1(2.89,35.36) v1(2.9,34.44) v1(2.89,31.09) v1(2.9,30.18) v1(3.02,51.1) v1(3,50.52) v1(3.01,49.56) v1(3.02,48.97) v1(3.02,33.83) v1(3,33.25) v1(3.01,32.28) v1(3.02,31.7) v1(3.37,51.1) v1(3.35,50.61) v1(3.35,49.46) v1(3.37,48.97) v1(3.37,33.83) v1(3.35,33.34) v1(3.35,32.19) v1(3.37,31.7) v1(3.73,51.1) v1(3.7,50.6) v1(3.7,49.47) v1(3.73,48.97) v1(3.73,33.83) v1(3.7,33.33) v1(3.7,32.2) v1(3.73,31.7) v1(3.82,56.21) v1(3.81,52.63) v1(3.81,51.71) v1(3.81,48.36) v1(3.81,47.45) v1(3.79,43.87) v1(3.82,38.94) v1(3.81,35.36) v1(3.81,34.44) v1(3.81,31.09) v1(3.81,30.18) v1(3.79,26.59) v1(4.08,51.1) v1(4.05,50.55) v1(4.05,49.53) v1(4.08,48.97) v1(4.08,33.83) v1(4.05,33.28) v1(4.05,32.26) v1(4.08,31.7) v1(4.4,50.55) v1(4.41,49.53) v1(4.4,33.27) v1(4.41,32.26) v1(4.44,51.1) v1(4.44,48.97) v1(4.44,33.83) v1(4.44,31.7) v1(4.72,55.37) v1(4.72,54.46) v1(4.72,53.67) v1(4.72,52.63) v1(4.72,51.71) v1(4.72,48.36) v1(4.72,47.45) v1(4.72,46.41) v1(4.72,45.62) v1(4.73,44.7) v1(4.72,38.1) v1(4.72,37.19) v1(4.72,36.4) v1(4.72,35.36) v1(4.72,34.44) v1(4.72,31.09) v1(4.72,30.18) v1(4.72,29.13) v1(4.72,28.35) v1(4.73,27.43) v1(4.74,56.21) v1(4.79,51.1) v1(4.76,50.55) v1(4.76,49.53) v1(4.79,48.97) v1(4.73,43.87) v1(4.74,38.94) v1(4.79,33.83) v1(4.76,33.27) v1(4.76,32.26) v1(4.79,31.7) v1(4.73,26.59) v1(5.11,50.55) v1(5.12,49.53) v1(5.11,33.27) v1(5.12,32.26) v1(5.14,51.1) v1(5.15,48.97) v1(5.14,33.83) v1(5.15,31.7) v1(5.5,51.11) v1(5.47,50.55) v1(5.47,49.53) v1(5.5,48.97) v1(5.5,33.83) v1(5.47,33.27) v1(5.47,32.26) v1(5.5,31.7) v1(5.66,56.21) v1(5.64,55.37) v1(5.64,54.46) v1(5.64,53.67) v1(5.64,52.63) v1(5.64,51.71) v1(5.64,48.36) v1(5.64,47.45) v1(5.64,46.41) v1(5.64,45.62) v1(5.64,44.7) v1(5.65,43.87) v1(5.66,38.94) v1(5.64,38.1) v1(5.64,37.19) v1(5.64,36.4) v1(5.64,35.36) v1(5.64,34.44) v1(5.64,31.09) v1(5.64,30.18) v1(5.64,29.13) v1(5.64,28.35) v1(5.64,27.43) v1(5.65,26.59) v1(5.82,50.55) v1(5.82,49.53) v1(5.82,33.27) v1(5.82,32.26) v1(5.85,51.11) v1(5.85,48.97) v1(5.85,33.83) v1(5.85,31.7) v1(6.21,51.11) v1(6.17,50.55) v1(6.18,49.53) v1(6.21,48.97) v1(6.21,33.83) v1(6.17,33.27) v1(6.18,32.26) v1(6.21,31.7) v1(6.53,50.55) v1(6.53,33.27) v1(6.56,56.21) v1(6.56,55.37) v1(6.55,54.46) v1(6.55,53.54) v1(6.55,52.63) v1(6.55,51.71) v1(6.56,51.11) v1(6.54,49.53) v1(6.56,48.97) v1(6.55,48.36) v1(6.55,47.45) v1(6.55,46.53) v1(6.55,45.62) v1(6.55,44.7) v1(6.56,43.87) v1(6.56,38.94) v1(6.56,38.1) v1(6.55,37.19) v1(6.55,36.27) v1(6.55,35.36) v1(6.55,34.44) v1(6.56,33.83) v1(6.54,32.26) v1(6.56,31.7) v1(6.55,31.09) v1(6.55,30.18) v1(6.55,29.26) v1(6.55,28.35) v1(6.55,27.43) v1(6.56,26.59) v1(6.91,51.1) v1(6.88,50.55) v1(6.9,49.53) v1(6.91,48.97) v1(6.91,33.83) v1(6.88,33.27) v1(6.9,32.26) v1(6.91,31.7) v1(7.27,51.1) v1(7.24,50.55) v1(7.25,49.53) v1(7.27,48.97) v1(7.27,33.83) v1(7.24,33.27) v1(7.25,32.26) v1(7.27,31.7) v1(7.45,56.21) v1(7.47,55.37) v1(7.47,54.46) v1(7.46,53.54) v1(7.47,52.63) v1(7.47,51.71) v1(7.47,48.36) v1(7.47,47.45) v1(7.47,46.53) v1(7.47,45.62) v1(7.47,44.7) v1(7.46,43.87) v1(7.45,38.94) v1(7.47,38.1) v1(7.47,37.19) v1(7.46,36.27) v1(7.47,35.36) v1(7.47,34.44) v1(7.47,31.09) v1(7.47,30.18) v1(7.47,29.26) v1(7.47,28.35) v1(7.47,27.43) v1(7.46,26.59) v1(7.62,51.1) v1(7.63,48.97) v1(7.62,33.83) v1(7.63,31.7) v1(7.67,50.55) v1(7.68,49.53) v1(7.65,33.27) v1(7.66,32.26) v1(11.63,73.48) v1(11.63,72.63) v1(11.63,71.73) v1(11.63,70.94) v1(11.63,69.9) v1(11.63,68.98) v1(11.63,68.38) v1(11.63,67.95) v1(11.63,66.67) v1(11.63,66.24) v1(11.63,65.63) v1(11.63,64.73) v1(11.63,62.89) v1(11.63,61.96) v1(11.63,61.14) v1(11.63,21.67) v1(11.63,20.82) v1(11.63,19.91) v1(11.63,19.13) v1(11.63,18.08) v1(11.63,17.17) v1(11.63,16.56) v1(11.63,16.14) v1(11.63,14.85) v1(11.63,14.43) v1(11.63,13.82) v1(11.63,12.92) v1(11.63,11.07) v1(11.63,10.14) v1(11.63,9.32) v1(11.64,63.68) v1(11.64,11.86) v1(11.99,68.38) v1(11.98,67.88) v1(11.99,66.74) v1(11.99,66.24) v1(11.99,16.56) v1(11.98,16.06) v1(11.99,14.93) v1(11.99,14.43) v1(12.33,67.81) v1(12.33,15.99) v1(12.34,68.38) v1(12.33,66.82) v1(12.34,66.24) v1(12.34,16.56) v1(12.33,15) v1(12.34,14.43) v1(12.52,72.64) v1(12.52,71.73) v1(12.52,70.94) v1(12.52,69.9) v1(12.52,68.99) v1(12.52,65.63) v1(12.52,64.72) v1(12.52,63.68) v1(12.52,62.89) v1(12.52,61.98) v1(12.53,61.14) v1(12.52,20.83) v1(12.52,19.91) v1(12.52,19.13) v1(12.52,18.08) v1(12.52,17.17) v1(12.52,13.82) v1(12.52,12.9) v1(12.52,11.86) v1(12.52,11.07) v1(12.52,10.16) v1(12.53,9.32) v1(12.54,73.48) v1(12.54,21.67) v1(12.7,68.38) v1(12.68,67.79) v1(12.69,66.83) v1(12.7,66.24) v1(12.7,16.56) v1(12.68,15.98) v1(12.69,15.01) v1(12.7,14.43) v1(13.06,68.38) v1(13.04,67.8) v1(13.04,66.83) v1(13.06,66.24) v1(13.06,16.56) v1(13.04,15.98) v1(13.04,15.01) v1(13.06,14.43) v1(13.41,68.38) v1(13.39,67.8) v1(13.4,66.83) v1(13.41,66.24) v1(13.41,16.56) v1(13.39,15.98) v1(13.4,15.01) v1(13.41,14.43) v1(13.47,73.48) v1(13.44,69.9) v1(13.44,68.99) v1(13.44,65.63) v1(13.44,64.72) v1(13.44,61.14) v1(13.47,21.67) v1(13.44,18.08) v1(13.44,17.17) v1(13.44,13.82) v1(13.44,12.9) v1(13.44,9.32) v1(13.76,68.38) v1(13.75,67.8) v1(13.75,66.83) v1(13.76,66.24) v1(13.76,16.56) v1(13.75,15.98) v1(13.75,15.01) v1(13.76,14.43) v1(14.12,68.38) v1(14.1,67.79) v1(14.11,66.83) v1(14.12,66.24) v1(14.12,16.56) v1(14.1,15.98) v1(14.11,15.01) v1(14.12,14.43) v1(14.35,69.9) v1(14.35,68.99) v1(14.35,65.63) v1(14.35,64.72) v1(14.35,18.08) v1(14.35,17.17) v1(14.35,13.82) v1(14.35,12.9) v1(14.47,68.38) v1(14.46,67.8) v1(14.46,66.83) v1(14.48,66.24) v1(14.47,16.56) v1(14.46,15.98) v1(14.46,15.01) v1(14.48,14.43) v1(14.83,68.38) v1(14.8,67.88) v1(14.8,66.73) v1(14.83,66.24) v1(14.83,16.56) v1(14.8,16.07) v1(14.8,14.92) v1(14.83,14.43) v1(15.18,68.38) v1(15.15,67.87) v1(15.16,66.74) v1(15.18,66.24) v1(15.18,16.56) v1(15.15,16.06) v1(15.16,14.93) v1(15.18,14.43) v1(15.27,73.48) v1(15.26,69.9) v1(15.27,68.99) v1(15.26,65.63) v1(15.27,64.72) v1(15.25,61.14) v1(15.27,21.67) v1(15.26,18.08) v1(15.27,17.17) v1(15.26,13.82) v1(15.27,12.9) v1(15.25,9.32) v1(15.5,67.82) v1(15.5,66.8) v1(15.5,16) v1(15.5,14.98) v1(15.54,68.38) v1(15.54,66.24) v1(15.54,16.56) v1(15.54,14.43) v1(15.89,68.38) v1(15.86,67.82) v1(15.86,66.8) v1(15.89,66.24) v1(15.89,16.56) v1(15.86,16) v1(15.86,14.99) v1(15.89,14.43) v1(16.19,73.48) v1(16.17,72.65) v1(16.18,71.73) v1(16.18,70.94) v1(16.18,69.9) v1(16.18,68.99) v1(16.21,67.82) v1(16.22,66.8) v1(16.18,65.63) v1(16.18,64.72) v1(16.18,63.68) v1(16.18,62.89) v1(16.18,61.98) v1(16.19,61.14) v1(16.19,21.67) v1(16.17,20.83) v1(16.18,19.91) v1(16.18,19.13) v1(16.18,18.08) v1(16.18,17.17) v1(16.21,16) v1(16.22,14.99) v1(16.18,13.82) v1(16.18,12.9) v1(16.18,11.86) v1(16.18,11.08) v1(16.18,10.16) v1(16.19,9.32) v1(16.25,68.38) v1(16.25,66.24) v1(16.25,16.56) v1(16.25,14.43) v1(16.6,68.38) v1(16.57,67.82) v1(16.57,66.8) v1(16.6,66.24) v1(16.6,16.56) v1(16.57,16) v1(16.57,14.99) v1(16.6,14.43) v1(16.92,67.82) v1(16.93,66.8) v1(16.92,16) v1(16.93,14.99) v1(16.95,68.38) v1(16.96,66.24) v1(16.95,16.56) v1(16.96,14.43) v1(17.11,73.48) v1(17.1,72.65) v1(17.09,71.73) v1(17.09,70.94) v1(17.09,69.9) v1(17.09,68.99) v1(17.09,65.63) v1(17.09,64.72) v1(17.09,63.68) v1(17.09,62.89) v1(17.09,61.98) v1(17.11,61.14) v1(17.11,21.67) v1(17.1,20.83) v1(17.09,19.91) v1(17.09,19.13) v1(17.09,18.08) v1(17.09,17.17) v1(17.09,13.82) v1(17.09,12.9) v1(17.09,11.86) v1(17.09,11.08) v1(17.09,10.16) v1(17.11,9.32) v1(17.31,68.38) v1(17.28,67.82) v1(17.28,66.8) v1(17.31,66.24) v1(17.31,16.56) v1(17.28,16) v1(17.28,14.99) v1(17.31,14.43) v1(17.63,67.82) v1(17.63,16) v1(17.66,68.38) v1(17.64,66.8) v1(17.66,66.24) v1(17.66,16.56) v1(17.64,14.99) v1(17.66,14.43) v1(18.02,73.48) v1(18.01,72.65) v1(18.01,71.73) v1(18.01,70.82) v1(18.01,69.9) v1(18.01,68.99) v1(18.01,68.38) v1(17.99,67.82) v1(18,66.8) v1(18.01,66.24) v1(18.01,65.63) v1(18.01,64.72) v1(18.01,63.8) v1(18.01,62.89) v1(18.01,61.98) v1(18.02,61.14) v1(18.02,21.67) v1(18.01,20.83) v1(18.01,19.91) v1(18.01,19) v1(18.01,18.08) v1(18.01,17.17) v1(18.01,16.56) v1(17.99,16) v1(18,14.99) v1(18.01,14.43) v1(18.01,13.82) v1(18.01,12.9) v1(18.01,11.99) v1(18.01,11.08) v1(18.01,10.16) v1(18.02,9.32) v1(18.37,68.38) v1(18.34,67.82) v1(18.35,66.8) v1(18.37,66.24) v1(18.37,16.56) v1(18.34,16) v1(18.35,14.99) v1(18.37,14.43) v1(18.72,68.38) v1(18.69,67.82) v1(18.71,66.8) v1(18.72,66.24) v1(18.72,16.56) v1(18.69,16) v1(18.71,14.99) v1(18.72,14.43) v1(18.91,73.48) v1(18.92,72.65) v1(18.92,71.73) v1(18.92,70.81) v1(18.92,69.9) v1(18.92,68.99) v1(18.92,65.63) v1(18.92,64.72) v1(18.92,63.8) v1(18.92,62.89) v1(18.92,61.97) v1(18.91,61.14) v1(18.91,21.67) v1(18.92,20.83) v1(18.92,19.91) v1(18.92,19) v1(18.92,18.08) v1(18.92,17.17) v1(18.92,13.82) v1(18.92,12.9) v1(18.92,11.99) v1(18.92,11.08) v1(18.92,10.15) v1(18.91,9.32) v1(19.08,68.38) v1(19.05,67.82) v1(19.06,66.8) v1(19.08,66.24) v1(19.08,16.56) v1(19.05,16) v1(19.06,14.99) v1(19.08,14.43) v1(36.65,7.45) v1(36.65,6.56) v1(36.65,5.66) v1(36.65,4.74) v1(36.65,3.82) v1(36.65,2.01) v1(36.65,1.08) v1(36.65,0.18) v1(37.49,7.47) v1(37.49,6.56) v1(37.49,5.64) v1(37.49,4.72) v1(37.49,1.07) v1(37.5,0.18) v1(38.4,7.47) v1(38.4,6.55) v1(38.4,5.64) v1(38.4,4.72) v1(38.41,1.07) v1(38.4,0.18) v1(39.19,5.64) v1(39.19,4.72) v1(39.19,1.07) v1(39.19,0.18) v1(39.32,7.46) v1(39.32,6.55) v1(40.23,7.47) v1(40.23,6.55) v1(40.23,5.64) v1(40.23,4.72) v1(40.23,3.81) v1(40.23,2.89) v1(40.23,1.98) v1(40.23,1.07) v1(40.24,0.18) v1(41.15,7.47) v1(41.15,6.55) v1(41.15,5.64) v1(41.15,4.72) v1(41.15,3.81) v1(41.15,2.9) v1(41.15,1.98) v1(41.15,1.07) v1(41.15,0.18) v1(41.76,7.62) v1(41.76,7.27) v1(41.76,6.91) v1(41.76,6.56) v1(41.76,6.21) v1(41.76,5.85) v1(41.76,5.5) v1(41.76,5.14) v1(41.76,4.79) v1(41.76,4.44) v1(41.76,4.08) v1(41.76,3.73) v1(41.76,3.37) v1(41.76,3.02) v1(41.76,2.66) v1(41.76,2.31) v1(41.76,1.95) v1(41.76,1.6) v1(41.76,1.25) v1(41.76,0.89) v1(41.76,0.53) v1(41.76,0.18) v1(42.18,0.18) v1(42.32,7.59) v1(42.32,7.24) v1(42.32,6.88) v1(42.32,6.53) v1(42.32,6.17) v1(42.32,5.82) v1(42.32,5.47) v1(42.32,5.11) v1(42.32,4.76) v1(42.32,4.4) v1(42.31,4.05) v1(42.26,3.7) v1(42.25,3.35) v1(42.33,0.87) v1(42.26,0.53) v1(42.34,3) v1(42.34,2.65) v1(42.34,2.3) v1(42.34,1.94) v1(42.34,1.58) v1(42.34,1.23) v1(43.33,7.61) v1(43.33,7.25) v1(43.33,6.9) v1(43.33,6.54) v1(43.33,6.18) v1(43.33,5.82) v1(43.33,5.47) v1(43.33,5.12) v1(43.33,4.76) v1(43.33,4.41) v1(43.33,4.05) v1(43.31,3.01) v1(43.31,2.65) v1(43.31,2.3) v1(43.31,1.94) v1(43.31,1.59) v1(43.31,1.23) v1(43.32,0.88) v1(43.39,3.7) v1(43.4,3.35) v1(43.39,0.53) v1(43.47,0.18) v1(43.89,7.63) v1(43.89,7.27) v1(43.89,6.91) v1(43.89,6.56) v1(43.89,6.21) v1(43.89,5.85) v1(43.89,5.5) v1(43.89,5.15) v1(43.89,4.79) v1(43.89,4.44) v1(43.89,4.08) v1(43.89,3.73) v1(43.89,3.37) v1(43.89,3.02) v1(43.89,2.67) v1(43.89,2.31) v1(43.89,1.96) v1(43.89,1.6) v1(43.89,1.25) v1(43.89,0.89) v1(43.89,0.53) v1(43.89,0.18) v1(44.5,7.47) v1(44.5,6.55) v1(44.5,5.64) v1(44.5,4.72) v1(44.5,3.81) v1(44.5,2.89) v1(44.5,1.98) v1(44.5,1.07) v1(44.5,0.18) v1(45.41,7.47) v1(45.41,6.55) v1(45.41,5.64) v1(45.41,4.72) v1(45.41,3.81) v1(45.41,2.9) v1(45.41,1.98) v1(45.41,1.07) v1(45.4,0.18) v1(46.33,7.47) v1(46.33,6.55) v1(46.46,5.64) v1(46.46,4.72) v1(46.46,1.06) v1(46.45,0.18) v1(47.24,7.47) v1(47.24,6.55) v1(47.24,5.64) v1(47.24,4.72) v1(47.24,1.07) v1(47.24,0.18) v1(48.16,7.47) v1(48.16,6.55) v1(48.16,5.64) v1(48.16,4.73) v1(48.16,1.07) v1(48.18,0.18) v1(49,7.46) v1(49,6.56) v1(49,5.65) v1(49,4.73) v1(49,3.79) v1(49,1.99) v1(49,1.07) v1(49,0.18) v1(56.97,7.45) v1(56.97,6.56) v1(56.97,5.66) v1(56.97,4.74) v1(56.97,3.82) v1(56.97,2.01) v1(56.97,1.08) v1(56.97,0.18) v1(57.81,7.47) v1(57.81,6.56) v1(57.81,5.64) v1(57.81,4.72) v1(57.81,1.07) v1(57.82,0.18) v1(58.72,7.47) v1(58.72,6.55) v1(58.72,5.64) v1(58.72,4.72) v1(58.73,1.07) v1(58.72,0.18) v1(59.51,5.64) v1(59.51,4.72) v1(59.51,1.07) v1(59.51,0.18) v1(59.64,7.46) v1(59.64,6.55) v1(60.55,7.47) v1(60.55,6.55) v1(60.55,5.64) v1(60.55,4.72) v1(60.55,3.81) v1(60.55,2.89) v1(60.55,1.98) v1(60.55,1.07) v1(60.56,0.18) v1(61.47,7.47) v1(61.47,6.55) v1(61.47,5.64) v1(61.47,4.72) v1(61.47,3.81) v1(61.47,2.9) v1(61.47,1.98) v1(61.47,1.07) v1(61.47,0.18) v1(62.08,7.62) v1(62.08,7.27) v1(62.08,6.91) v1(62.08,6.56) v1(62.08,6.21) v1(62.08,5.85) v1(62.08,5.5) v1(62.08,5.14) v1(62.08,4.79) v1(62.08,4.44) v1(62.08,4.08) v1(62.08,3.73) v1(62.08,3.37) v1(62.08,3.02) v1(62.08,2.66) v1(62.08,2.31) v1(62.08,1.95) v1(62.08,1.6) v1(62.08,1.25) v1(62.08,0.89) v1(62.08,0.53) v1(62.08,0.18) v1(62.5,0.18) v1(62.61,41.31) v1(62.63,4.05) v1(62.58,3.7) v1(62.57,3.35) v1(62.58,0.53) v1(62.64,7.59) v1(62.64,7.24) v1(62.64,6.88) v1(62.64,6.53) v1(62.64,6.17) v1(62.64,5.82) v1(62.64,5.47) v1(62.64,5.11) v1(62.64,4.76) v1(62.64,4.4) v1(62.66,3) v1(62.66,2.65) v1(62.66,2.3) v1(62.66,1.94) v1(62.66,1.58) v1(62.66,1.23) v1(62.65,0.87) v1(63.63,3.01) v1(63.63,2.65) v1(63.63,2.3) v1(63.63,1.94) v1(63.63,1.59) v1(63.63,1.23) v1(63.65,7.61) v1(63.65,7.25) v1(63.65,6.9) v1(63.65,6.54) v1(63.65,6.18) v1(63.65,5.82) v1(63.65,5.47) v1(63.65,5.12) v1(63.65,4.76) v1(63.65,4.41) v1(63.65,4.05) v1(63.71,3.7) v1(63.72,3.35) v1(63.64,0.88) v1(63.71,0.53) v1(63.79,0.18) v1(64.21,7.63) v1(64.21,7.27) v1(64.21,6.91) v1(64.21,6.56) v1(64.21,6.21) v1(64.21,5.85) v1(64.21,5.5) v1(64.21,5.15) v1(64.21,4.79) v1(64.21,4.44) v1(64.21,4.08) v1(64.21,3.73) v1(64.21,3.37) v1(64.21,3.02) v1(64.21,2.67) v1(64.21,2.31) v1(64.21,1.96) v1(64.21,1.6) v1(64.21,1.25) v1(64.21,0.89) v1(64.21,0.53) v1(64.21,0.18) v1(64.82,7.47) v1(64.82,6.55) v1(64.82,5.64) v1(64.82,4.72) v1(64.82,3.81) v1(64.82,2.89) v1(64.82,1.98) v1(64.82,1.07) v1(64.82,0.18) v1(65.73,7.47) v1(65.73,6.55) v1(65.73,5.64) v1(65.73,4.72) v1(65.73,3.81) v1(65.73,2.9) v1(65.73,1.98) v1(65.73,1.07) v1(65.72,0.18) v1(66.65,7.47) v1(66.65,6.55) v1(66.78,5.64) v1(66.78,4.72) v1(66.78,1.06) v1(66.77,0.18) v1(67.56,7.47) v1(67.56,6.55) v1(67.56,5.64) v1(67.56,4.72) v1(67.56,1.07) v1(67.56,0.18) v1(68.48,7.47) v1(68.48,6.55) v1(68.48,5.64) v1(68.48,4.73) v1(68.48,1.07) v1(68.5,0.18) v1(69.32,7.46) v1(69.32,6.56) v1(69.32,5.65) v1(69.32,4.73) v1(69.32,3.79) v1(69.32,1.99) v1(69.32,1.07) v1(69.32,0.18) v1(86.16,16) v1(86.18,14.43) v1(86.26,14.99) v1(86.42,16.6) v1(86.55,16) v1(86.56,14.99) v1(86.54,14.43) v1(86.79,67.82) v1(86.89,68.38) v1(86.89,66.8) v1(86.89,66.24) v1(86.89,16.56) v1(86.91,16) v1(86.92,14.99) v1(86.89,14.43) v1(87.06,73.48) v1(87.05,72.65) v1(87.05,71.73) v1(87.05,70.82) v1(87.05,69.9) v1(87.05,68.99) v1(87.05,65.63) v1(87.05,64.72) v1(87.05,63.81) v1(87.05,62.89) v1(87.05,61.97) v1(87.06,61.14) v1(87.06,21.67) v1(87.05,20.83) v1(87.05,19.91) v1(87.05,19) v1(87.05,18.08) v1(87.05,17.17) v1(87.05,13.82) v1(87.05,12.9) v1(87.05,11.99) v1(87.05,11.07) v1(87.05,10.16) v1(87.06,9.32) v1(87.24,68.38) v1(87.27,67.82) v1(87.27,66.8) v1(87.25,66.24) v1(87.24,16.56) v1(87.26,16) v1(87.27,14.99) v1(87.25,14.43) v1(87.6,68.38) v1(87.62,67.82) v1(87.63,66.8) v1(87.6,66.24) v1(87.6,16.56) v1(87.62,16) v1(87.63,14.99) v1(87.6,14.43) v1(87.95,73.48) v1(87.96,72.64) v1(87.96,71.73) v1(87.96,70.82) v1(87.96,69.9) v1(87.96,68.99) v1(87.96,68.38) v1(87.98,67.82) v1(87.98,66.8) v1(87.95,66.24) v1(87.96,65.63) v1(87.96,64.72) v1(87.96,63.8) v1(87.96,62.89) v1(87.96,61.97) v1(87.95,61.14) v1(87.95,21.67) v1(87.96,20.83) v1(87.96,19.91) v1(87.96,19) v1(87.96,18.08) v1(87.96,17.17) v1(87.96,16.56) v1(87.97,16) v1(87.98,14.99) v1(87.95,14.43) v1(87.96,13.82) v1(87.96,12.9) v1(87.96,11.99) v1(87.96,11.07) v1(87.96,10.16) v1(87.95,9.32) v1(88.31,68.38) v1(88.33,67.82) v1(88.31,66.24) v1(88.31,16.56) v1(88.33,16) v1(88.31,14.43) v1(88.34,66.8) v1(88.34,14.99) v1(88.66,68.38) v1(88.68,67.82) v1(88.69,66.8) v1(88.66,66.24) v1(88.66,16.56) v1(88.69,16) v1(88.69,14.99) v1(88.66,14.43) v1(88.86,73.48) v1(88.87,72.64) v1(88.88,71.73) v1(88.87,70.94) v1(88.87,69.9) v1(88.88,68.99) v1(88.87,65.63) v1(88.88,64.72) v1(88.87,63.68) v1(88.87,62.89) v1(88.87,61.97) v1(88.86,61.14) v1(88.86,21.67) v1(88.87,20.83) v1(88.88,19.91) v1(88.87,19.13) v1(88.87,18.08) v1(88.88,17.17) v1(88.87,13.82) v1(88.88,12.9) v1(88.87,11.86) v1(88.87,11.07) v1(88.87,10.16) v1(88.86,9.32) v1(89.01,68.38) v1(89.01,66.24) v1(89.01,16.56) v1(89.01,14.43) v1(89.04,67.82) v1(89.04,66.8) v1(89.04,16) v1(89.05,14.99) v1(89.37,68.38) v1(89.4,67.82) v1(89.4,66.8) v1(89.37,66.24) v1(89.37,16.56) v1(89.4,16) v1(89.4,14.99) v1(89.37,14.43) v1(89.72,68.38) v1(89.72,66.24) v1(89.72,16.56) v1(89.72,14.43) v1(89.78,73.48) v1(89.79,72.64) v1(89.79,71.73) v1(89.79,70.94) v1(89.79,69.9) v1(89.79,68.99) v1(89.75,67.82) v1(89.76,66.8) v1(89.79,65.63) v1(89.79,64.72) v1(89.79,63.68) v1(89.79,62.89) v1(89.79,61.97) v1(89.78,61.14) v1(89.78,21.67) v1(89.79,20.83) v1(89.79,19.91) v1(89.79,19.13) v1(89.79,18.08) v1(89.79,17.17) v1(89.75,16) v1(89.76,14.99) v1(89.79,13.82) v1(89.79,12.9) v1(89.79,11.86) v1(89.79,11.07) v1(89.79,10.16) v1(89.78,9.32) v1(90.08,68.38) v1(90.11,67.82) v1(90.11,66.8) v1(90.08,66.24) v1(90.08,16.56) v1(90.11,16) v1(90.11,14.99) v1(90.08,14.43) v1(90.43,68.38) v1(90.43,66.24) v1(90.43,16.56) v1(90.43,14.43) v1(90.46,67.82) v1(90.47,66.8) v1(90.46,16) v1(90.47,14.98) v1(90.72,73.48) v1(90.7,69.9) v1(90.7,68.99) v1(90.7,65.63) v1(90.7,64.72) v1(90.7,61.14) v1(90.72,21.67) v1(90.7,18.08) v1(90.7,17.17) v1(90.7,13.82) v1(90.7,12.9) v1(90.7,9.32) v1(90.79,68.38) v1(90.81,67.88) v1(90.82,66.75) v1(90.79,66.24) v1(90.79,16.56) v1(90.81,16.06) v1(90.82,14.93) v1(90.79,14.43) v1(91.14,68.38) v1(91.17,67.89) v1(91.17,66.74) v1(91.14,66.24) v1(91.14,16.56) v1(91.17,16.07) v1(91.17,14.92) v1(91.14,14.43) v1(91.49,68.38) v1(91.51,67.79) v1(91.51,66.82) v1(91.5,66.24) v1(91.49,16.56) v1(91.51,15.98) v1(91.51,15.01) v1(91.5,14.43) v1(91.62,69.9) v1(91.62,68.99) v1(91.62,65.63) v1(91.62,64.72) v1(91.62,18.08) v1(91.62,17.17) v1(91.62,13.82) v1(91.62,12.9) v1(91.85,68.38) v1(91.86,67.79) v1(91.86,66.83) v1(91.85,66.24) v1(91.85,16.56) v1(91.86,15.98) v1(91.86,15.01) v1(91.85,14.43) v1(92.2,68.38) v1(92.22,67.79) v1(92.22,66.82) v1(92.2,66.24) v1(92.2,16.56) v1(92.22,15.98) v1(92.22,15.01) v1(92.2,14.43) v1(92.52,73.48) v1(92.53,69.9) v1(92.53,68.99) v1(92.53,65.63) v1(92.53,64.72) v1(92.5,61.14) v1(92.52,21.67) v1(92.53,18.08) v1(92.53,17.17) v1(92.53,13.82) v1(92.53,12.9) v1(92.5,9.32) v1(92.56,68.38) v1(92.57,67.79) v1(92.58,66.82) v1(92.56,66.24) v1(92.56,16.56) v1(92.57,15.98) v1(92.58,15.01) v1(92.56,14.43) v1(92.91,68.38) v1(92.93,67.79) v1(92.93,66.82) v1(92.91,66.24) v1(92.91,16.56) v1(92.93,15.98) v1(92.93,15.01) v1(92.91,14.43) v1(93.27,68.38) v1(93.28,67.79) v1(93.29,66.83) v1(93.27,66.24) v1(93.27,16.56) v1(93.28,15.98) v1(93.29,15.01) v1(93.27,14.43) v1(93.43,61.14) v1(93.43,9.32) v1(93.44,73.48) v1(93.45,72.64) v1(93.45,71.73) v1(93.45,70.94) v1(93.45,69.9) v1(93.45,68.99) v1(93.45,65.63) v1(93.45,64.72) v1(93.45,63.68) v1(93.45,62.89) v1(93.45,61.98) v1(93.44,21.67) v1(93.45,20.83) v1(93.45,19.91) v1(93.45,19.13) v1(93.45,18.08) v1(93.45,17.17) v1(93.45,13.82) v1(93.45,12.9) v1(93.45,11.86) v1(93.45,11.08) v1(93.45,10.16) v1(93.62,68.38) v1(93.63,67.8) v1(93.62,66.24) v1(93.62,16.56) v1(93.63,15.99) v1(93.62,14.43) v1(93.64,66.81) v1(93.64,15) v1(93.98,68.38) v1(93.98,67.88) v1(93.99,66.74) v1(93.98,66.24) v1(93.98,16.56) v1(93.98,16.06) v1(93.99,14.93) v1(93.98,14.43) v1(94.33,70.94) v1(94.33,19.12) v1(94.33,73.48) v1(94.33,72.66) v1(94.33,71.73) v1(94.33,69.89) v1(94.34,68.99) v1(94.33,68.38) v1(94.33,67.95) v1(94.33,66.67) v1(94.33,66.24) v1(94.33,65.64) v1(94.33,64.72) v1(94.34,63.68) v1(94.33,62.89) v1(94.33,61.99) v1(94.33,61.14) v1(94.34,21.67) v1(94.34,20.85) v1(94.34,19.91) v1(94.34,18.07) v1(94.34,17.17) v1(94.34,16.56) v1(94.34,16.14) v1(94.34,14.85) v1(94.34,14.43) v1(94.34,13.82) v1(94.34,12.91) v1(94.34,11.86) v1(94.34,11.07) v1(94.34,10.17) v1(94.34,9.32) v1(98.31,50.55) v1(98.32,49.53) v1(98.28,33.27) v1(98.3,32.26) v1(98.34,51.11) v1(98.35,48.97) v1(98.34,33.83) v1(98.35,31.7) v1(98.51,56.21) v1(98.5,55.38) v1(98.5,54.46) v1(98.5,53.54) v1(98.5,52.63) v1(98.5,51.71) v1(98.5,48.36) v1(98.5,47.45) v1(98.5,46.53) v1(98.5,45.62) v1(98.5,44.7) v1(98.51,43.87) v1(98.51,38.94) v1(98.5,38.11) v1(98.5,37.18) v1(98.5,36.27) v1(98.5,35.36) v1(98.5,34.44) v1(98.5,31.09) v1(98.5,30.18) v1(98.5,29.26) v1(98.5,28.35) v1(98.5,27.43) v1(98.51,26.59) v1(98.7,51.11) v1(98.72,50.55) v1(98.73,49.53) v1(98.7,48.97) v1(98.7,33.83) v1(98.72,33.27) v1(98.73,32.26) v1(98.7,31.7) v1(99.05,51.11) v1(99.07,50.55) v1(99.09,49.53) v1(99.06,48.97) v1(99.05,33.83) v1(99.07,33.27) v1(99.09,32.26) v1(99.06,31.7) v1(99.41,56.21) v1(99.41,55.37) v1(99.42,54.46) v1(99.42,53.54) v1(99.42,52.63) v1(99.42,51.71) v1(99.41,51.11) v1(99.43,50.55) v1(99.41,48.97) v1(99.42,48.36) v1(99.42,47.45) v1(99.42,46.53) v1(99.42,45.62) v1(99.41,44.7) v1(99.41,43.87) v1(99.41,38.94) v1(99.41,38.1) v1(99.42,37.18) v1(99.42,36.27) v1(99.42,35.36) v1(99.42,34.44) v1(99.41,33.83) v1(99.43,33.27) v1(99.41,31.7) v1(99.42,31.09) v1(99.42,30.18) v1(99.42,29.26) v1(99.42,28.35) v1(99.41,27.43) v1(99.41,26.59) v1(99.44,49.53) v1(99.44,32.26) v1(99.76,51.11) v1(99.79,50.55) v1(99.79,49.53) v1(99.76,48.97) v1(99.76,33.83) v1(99.79,33.27) v1(99.79,32.26) v1(99.76,31.7) v1(100.12,51.11) v1(100.12,48.97) v1(100.12,33.83) v1(100.12,31.7) v1(100.14,50.55) v1(100.14,49.53) v1(100.14,33.27) v1(100.14,32.26) v1(100.32,56.21) v1(100.33,55.37) v1(100.33,54.46) v1(100.33,53.67) v1(100.33,52.63) v1(100.33,51.71) v1(100.33,48.36) v1(100.33,47.45) v1(100.33,46.41) v1(100.33,45.62) v1(100.32,44.7) v1(100.31,43.87) v1(100.32,38.94) v1(100.33,38.1) v1(100.33,37.18) v1(100.33,36.4) v1(100.33,35.36) v1(100.33,34.44) v1(100.33,31.09) v1(100.33,30.18) v1(100.33,29.13) v1(100.33,28.35) v1(100.32,27.43) v1(100.31,26.59) v1(100.47,51.11) v1(100.5,50.55) v1(100.5,49.53) v1(100.47,48.97) v1(100.47,33.83) v1(100.5,33.27) v1(100.5,32.26) v1(100.47,31.7) v1(100.82,51.11) v1(100.82,48.97) v1(100.82,33.83) v1(100.82,31.7) v1(100.85,50.55) v1(100.86,49.53) v1(100.85,33.27) v1(100.86,32.26) v1(101.23,56.21) v1(101.18,51.11) v1(101.21,50.55) v1(101.21,49.53) v1(101.18,48.97) v1(101.23,43.87) v1(101.23,38.94) v1(101.18,33.83) v1(101.21,33.27) v1(101.21,32.26) v1(101.18,31.7) v1(101.23,26.59) v1(101.24,55.37) v1(101.25,54.46) v1(101.24,53.67) v1(101.24,52.63) v1(101.25,51.71) v1(101.24,48.36) v1(101.25,47.45) v1(101.24,46.41) v1(101.24,45.62) v1(101.25,44.7) v1(101.24,38.1) v1(101.25,37.18) v1(101.24,36.4) v1(101.24,35.36) v1(101.25,34.44) v1(101.24,31.09) v1(101.25,30.18) v1(101.24,29.13) v1(101.24,28.35) v1(101.25,27.43) v1(101.53,51.11) v1(101.53,48.97) v1(101.53,33.83) v1(101.53,31.7) v1(101.56,50.55) v1(101.57,49.53) v1(101.56,33.27) v1(101.57,32.26) v1(101.88,51.11) v1(101.92,50.55) v1(101.92,49.53) v1(101.89,48.97) v1(101.88,33.83) v1(101.92,33.28) v1(101.92,32.26) v1(101.89,31.7) v1(102.17,56.21) v1(102.16,52.63) v1(102.16,51.71) v1(102.16,48.36) v1(102.16,47.45) v1(102.15,43.87) v1(102.17,38.94) v1(102.16,35.36) v1(102.16,34.44) v1(102.16,31.09) v1(102.16,30.18) v1(102.15,26.59) v1(102.24,51.11) v1(102.27,50.6) v1(102.27,49.47) v1(102.24,48.97) v1(102.24,33.83) v1(102.27,33.33) v1(102.27,32.2) v1(102.24,31.7) v1(102.59,51.11) v1(102.62,50.61) v1(102.62,49.46) v1(102.6,48.97) v1(102.59,33.83) v1(102.62,33.34) v1(102.62,32.19) v1(102.6,31.7) v1(102.95,51.11) v1(102.96,50.52) v1(102.97,49.55) v1(102.95,48.97) v1(102.95,33.83) v1(102.96,33.25) v1(102.97,32.28) v1(102.95,31.7) v1(103.07,52.63) v1(103.07,51.71) v1(103.07,48.36) v1(103.07,47.45) v1(103.07,35.36) v1(103.07,34.44) v1(103.07,31.09) v1(103.07,30.18) v1(103.3,51.11) v1(103.32,50.52) v1(103.32,49.56) v1(103.3,48.97) v1(103.3,33.83) v1(103.32,33.25) v1(103.32,32.28) v1(103.3,31.7) v1(103.66,51.11) v1(103.67,50.52) v1(103.67,49.55) v1(103.66,48.97) v1(103.66,33.83) v1(103.67,33.25) v1(103.67,32.28) v1(103.66,31.7) v1(103.98,56.21) v1(103.99,52.63) v1(103.99,51.71) v1(104.01,51.11) v1(104.03,50.52) v1(104.03,49.55) v1(104.02,48.97) v1(103.99,48.36) v1(103.99,47.45) v1(103.95,43.87) v1(103.98,38.94) v1(103.99,35.36) v1(103.99,34.44) v1(104.01,33.83) v1(104.03,33.25) v1(104.03,32.28) v1(104.02,31.7) v1(103.99,31.09) v1(103.99,30.18) v1(103.95,26.59) v1(104.37,51.11) v1(104.38,50.52) v1(104.39,49.55) v1(104.37,48.97) v1(104.37,33.83) v1(104.38,33.25) v1(104.39,32.28) v1(104.37,31.7) v1(104.72,51.11) v1(104.73,50.52) v1(104.72,48.97) v1(104.72,33.83) v1(104.73,33.25) v1(104.72,31.7) v1(104.74,49.56) v1(104.74,32.28) v1(104.9,56.21) v1(104.9,55.37) v1(104.9,54.46) v1(104.9,53.67) v1(104.9,52.63) v1(104.9,51.71) v1(104.9,48.36) v1(104.9,47.45) v1(104.9,46.41) v1(104.9,45.62) v1(104.9,44.7) v1(104.88,43.87) v1(104.9,38.94) v1(104.9,38.1) v1(104.9,37.19) v1(104.9,36.4) v1(104.9,35.36) v1(104.9,34.44) v1(104.9,31.09) v1(104.9,30.18) v1(104.9,29.13) v1(104.9,28.35) v1(104.9,27.43) v1(104.88,26.59) v1(105.08,51.11) v1(105.09,50.53) v1(105.1,49.54) v1(105.08,48.97) v1(105.08,33.83) v1(105.09,33.26) v1(105.1,32.27) v1(105.08,31.7) v1(105.43,51.11) v1(105.44,50.61) v1(105.44,49.47) v1(105.43,48.97) v1(105.43,33.83) v1(105.44,33.33) v1(105.44,32.2) v1(105.43,31.7) v1(105.79,56.21) v1(105.79,55.39) v1(105.79,54.46) v1(105.79,53.67) v1(105.79,52.61) v1(105.79,51.72) v1(105.79,51.11) v1(105.79,50.68) v1(105.79,49.4) v1(105.79,48.97) v1(105.79,48.37) v1(105.79,47.45) v1(105.79,46.41) v1(105.79,45.62) v1(105.79,44.72) v1(105.79,43.87) v1(105.79,38.94) v1(105.79,38.12) v1(105.79,37.19) v1(105.79,36.4) v1(105.79,35.34) v1(105.79,34.44) v1(105.79,33.83) v1(105.79,33.41) v1(105.79,32.12) v1(105.79,31.7) v1(105.79,31.09) v1(105.79,30.18) v1(105.79,29.13) v1(105.79,28.35) v1(105.79,27.44) v1(105.79,26.59) v5(0.25,42.16) v5(4.06,42.16) v5(7.87,42.16) v5(8.07,50.55) v5(8.1,49.53) v5(8.08,33.28) v5(8.1,32.26) v5(8.43,50.55) v5(8.43,33.28) v5(8.45,49.53) v5(8.45,32.26) v5(8.81,50.55) v5(8.81,49.53) v5(8.81,33.27) v5(8.81,32.26) v5(9.16,50.55) v5(9.16,49.53) v5(9.16,33.27) v5(9.16,32.26) v5(9.52,50.55) v5(9.52,49.53) v5(9.52,33.27) v5(9.52,32.26) v5(9.78,55.5) v5(9.78,51.69) v5(9.78,47.88) v5(9.78,44.07) v5(9.78,40.26) v5(9.78,36.45) v5(9.78,28.83) v5(9.87,50.55) v5(9.87,49.53) v5(9.87,33.27) v5(9.87,32.26) v5(10.23,50.55) v5(10.23,49.53) v5(10.23,33.27) v5(10.23,32.26) v5(10.59,50.55) v5(10.59,49.53) v5(10.59,33.27) v5(10.59,32.26) v5(10.94,50.55) v5(10.94,49.53) v5(10.94,33.27) v5(10.94,32.26) v5(11.3,50.55) v5(11.3,49.53) v5(11.3,33.27) v5(11.3,32.26) v5(11.68,99.31) v5(11.68,95.5) v5(11.68,91.69) v5(11.68,87.88) v5(11.68,84.07) v5(11.68,80.26) v5(11.68,76.45) v5(11.68,57.4) v5(11.68,53.59) v5(11.65,50.55) v5(11.65,49.53) v5(11.68,45.97) v5(11.68,42.16) v5(11.68,38.35) v5(11.68,34.54) v5(11.65,33.27) v5(11.65,32.26) v5(11.68,30.73) v5(11.68,26.92) v5(11.68,23.11) v5(11.68,7.87) v5(11.68,4.06) v5(11.68,0.25) v5(12.01,50.55) v5(12.01,49.53) v5(12.01,33.27) v5(12.01,32.26) v5(12.36,50.55) v5(12.36,49.53) v5(12.36,33.27) v5(12.36,32.26) v5(12.72,50.55) v5(12.72,49.53) v5(12.72,33.27) v5(12.72,32.26) v5(13.07,50.55) v5(13.07,49.53) v5(13.07,33.27) v5(13.07,32.26) v5(13.43,50.55) v5(13.43,49.53) v5(13.43,33.27) v5(13.43,32.26) v5(13.59,93.6) v5(13.59,89.79) v5(13.59,85.98) v5(13.59,82.17) v5(13.59,78.36) v5(13.59,59.31) v5(13.59,55.5) v5(13.59,51.69) v5(13.59,47.88) v5(13.59,44.07) v5(13.59,40.26) v5(13.59,36.45) v5(13.59,28.83) v5(13.59,25.02) v5(13.59,5.97) v5(13.59,2.16) v5(13.79,50.55) v5(13.79,49.53) v5(13.79,33.27) v5(13.79,32.26) v5(14.14,50.55) v5(14.14,49.53) v5(14.14,33.27) v5(14.14,32.26) v5(14.5,50.55) v5(14.5,49.53) v5(14.5,33.27) v5(14.5,32.26) v5(14.85,50.55) v5(14.85,49.53) v5(14.85,33.27) v5(14.85,32.26) v5(15.21,50.55) v5(15.21,49.53) v5(15.21,33.27) v5(15.21,32.26) v5(15.49,99.31) v5(15.49,91.69) v5(15.49,87.88) v5(15.49,84.07) v5(15.49,80.26) v5(15.49,76.45) v5(15.49,57.4) v5(15.49,53.59) v5(15.49,45.97) v5(15.49,42.16) v5(15.49,38.35) v5(15.49,34.54) v5(15.49,30.73) v5(15.49,26.92) v5(15.49,23.11) v5(15.49,7.87) v5(15.49,0.25) v5(15.56,50.55) v5(15.56,49.53) v5(15.56,33.27) v5(15.56,32.26) v5(15.92,50.55) v5(15.92,49.53) v5(15.92,33.27) v5(15.92,32.26) v5(16.27,50.55) v5(16.27,49.53) v5(16.27,33.27) v5(16.27,32.26) v5(16.63,50.55) v5(16.63,49.53) v5(16.63,33.27) v5(16.63,32.26) v5(16.99,50.55) v5(16.99,49.53) v5(16.99,33.27) v5(16.99,32.26) v5(17.4,93.6) v5(17.4,89.79) v5(17.4,85.98) v5(17.4,82.17) v5(17.4,78.36) v5(17.4,59.31) v5(17.4,55.5) v5(17.4,51.69) v5(17.34,50.55) v5(17.34,49.53) v5(17.4,47.88) v5(17.4,44.07) v5(17.4,40.26) v5(17.4,36.45) v5(17.34,33.27) v5(17.34,32.26) v5(17.4,28.83) v5(17.4,25.02) v5(17.4,5.97) v5(17.7,50.55) v5(17.7,49.53) v5(17.7,33.27) v5(17.7,32.26) v5(18.05,50.55) v5(18.05,49.53) v5(18.05,33.27) v5(18.05,32.26) v5(18.41,50.55) v5(18.41,49.53) v5(18.41,33.27) v5(18.41,32.26) v5(18.76,50.55) v5(18.76,49.53) v5(18.76,33.27) v5(18.76,32.26) v5(19.12,50.55) v5(19.12,49.53) v5(19.12,33.27) v5(19.12,32.26) v5(19.3,99.31) v5(19.3,95.5) v5(19.3,91.69) v5(19.3,87.88) v5(19.3,84.07) v5(19.3,80.26) v5(19.3,76.45) v5(19.3,57.4) v5(19.3,53.59) v5(19.3,45.97) v5(19.3,42.16) v5(19.3,38.35) v5(19.3,34.54) v5(19.3,30.73) v5(19.3,26.92) v5(19.3,23.11) v5(19.3,7.87) v5(19.3,4.06) v5(19.3,0.25) v5(19.43,14.99) v5(19.53,67.82) v5(19.49,66.8) v5(19.48,50.55) v5(19.48,49.53) v5(19.48,33.27) v5(19.48,32.26) v5(19.46,16) v5(19.83,50.55) v5(19.83,49.53) v5(19.83,33.27) v5(19.83,32.26) v5(19.85,66.8) v5(19.85,16) v5(19.91,14.99) v5(20.02,67.82) v5(20.2,66.8) v5(20.19,50.55) v5(20.19,49.53) v5(20.19,33.27) v5(20.19,32.26) v5(20.2,16) v5(20.38,67.82) v5(20.38,14.99) v5(20.56,66.8) v5(20.54,50.55) v5(20.54,49.53) v5(20.54,33.27) v5(20.54,32.26) v5(20.56,16) v5(20.73,67.82) v5(20.73,14.99) v5(20.92,66.8) v5(20.9,50.55) v5(20.9,49.53) v5(20.9,33.27) v5(20.9,32.26) v5(20.92,16) v5(21.09,67.82) v5(21.09,14.99) v5(21.21,97.41) v5(21.21,93.6) v5(21.21,89.79) v5(21.21,85.98) v5(21.21,82.17) v5(21.21,78.36) v5(21.21,74.55) v5(21.21,70.74) v5(21.21,63.12) v5(21.21,59.31) v5(21.21,55.5) v5(21.21,51.69) v5(21.21,47.88) v5(21.21,44.07) v5(21.21,40.26) v5(21.21,36.45) v5(21.21,28.83) v5(21.21,25.02) v5(21.21,21.21) v5(21.21,17.4) v5(21.21,9.78) v5(21.21,5.97) v5(21.21,2.16) v5(21.27,66.8) v5(21.25,50.55) v5(21.25,49.53) v5(21.25,33.27) v5(21.25,32.26) v5(21.27,16) v5(21.45,67.82) v5(21.45,14.99) v5(21.63,66.8) v5(21.61,50.55) v5(21.61,49.53) v5(21.61,33.27) v5(21.61,32.26) v5(21.63,16) v5(21.8,67.82) v5(21.8,14.99) v5(21.98,66.8) v5(21.96,50.55) v5(21.96,49.53) v5(21.96,33.27) v5(21.96,32.26) v5(21.98,16) v5(22.16,67.82) v5(22.16,14.99) v5(22.32,50.55) v5(22.32,49.53) v5(22.32,33.27) v5(22.32,32.26) v5(22.34,66.8) v5(22.34,16) v5(22.51,67.81) v5(22.51,14.99) v5(22.69,66.79) v5(22.68,50.55) v5(22.68,49.53) v5(22.68,33.27) v5(22.68,32.26) v5(22.69,16.01) v5(22.87,67.81) v5(22.87,15) v5(23.03,50.55) v5(23.03,49.53) v5(23.03,33.27) v5(23.03,32.26) v5(23.11,99.31) v5(23.11,80.26) v5(23.11,76.45) v5(23.11,72.64) v5(23.11,68.83) v5(23.05,66.79) v5(23.11,65.02) v5(23.11,61.21) v5(23.11,57.4) v5(23.11,53.59) v5(23.11,45.97) v5(23.11,42.16) v5(23.11,38.35) v5(23.11,34.54) v5(23.11,26.92) v5(23.11,23.11) v5(23.11,19.3) v5(23.05,16.02) v5(23.11,11.68) v5(23.11,7.87) v5(23.11,4.06) v5(23.11,0.25) v5(23.22,67.8) v5(23.22,15.01) v5(23.4,66.77) v5(23.39,50.55) v5(23.39,49.53) v5(23.39,33.27) v5(23.39,32.26) v5(23.4,16.03) v5(23.58,67.78) v5(23.58,15.02) v5(23.76,66.76) v5(23.74,50.55) v5(23.74,49.53) v5(23.74,33.27) v5(23.74,32.26) v5(23.76,16.05) v5(23.93,67.76) v5(23.93,15.04) v5(24.12,66.74) v5(24.1,50.55) v5(24.1,49.53) v5(24.1,33.27) v5(24.1,32.26) v5(24.12,16.07) v5(24.29,67.74) v5(24.29,15.06) v5(24.47,66.71) v5(24.45,50.55) v5(24.45,49.53) v5(24.45,33.27) v5(24.45,32.26) v5(24.47,16.09) v5(24.64,67.72) v5(24.64,15.09) v5(24.82,66.68) v5(24.81,50.55) v5(24.81,49.53) v5(24.81,33.27) v5(24.81,32.26) v5(24.82,16.12) v5(25.02,85.98) v5(25.02,74.55) v5(25.02,70.74) v5(25,67.69) v5(25.02,63.12) v5(25.02,59.31) v5(25.02,55.5) v5(25.02,51.69) v5(25.02,47.88) v5(25.02,44.07) v5(25.02,40.26) v5(25.02,36.45) v5(25.02,28.83) v5(25.02,25.02) v5(25.02,21.21) v5(25.02,17.4) v5(25,15.12) v5(25.02,13.59) v5(25.02,9.78) v5(25.02,5.97) v5(25.02,2.16) v5(25.18,66.65) v5(25.16,50.55) v5(25.16,49.53) v5(25.16,33.27) v5(25.16,32.26) v5(25.18,16.15) v5(25.35,67.66) v5(25.35,15.15) v5(25.53,66.62) v5(25.52,50.55) v5(25.52,49.53) v5(25.52,33.27) v5(25.52,32.26) v5(25.53,16.19) v5(25.71,67.62) v5(25.71,15.18) v5(25.89,66.58) v5(25.88,50.55) v5(25.88,49.53) v5(25.88,33.27) v5(25.88,32.26) v5(25.89,16.23) v5(26.06,67.58) v5(26.06,15.22) v5(26.23,50.55) v5(26.23,49.53) v5(26.23,33.27) v5(26.23,32.26) v5(26.24,66.54) v5(26.24,16.27) v5(26.41,67.54) v5(26.41,15.26) v5(26.59,66.49) v5(26.59,50.55) v5(26.59,49.53) v5(26.59,33.27) v5(26.59,32.26) v5(26.59,16.31) v5(26.76,67.49) v5(26.76,15.31) v5(26.92,99.31) v5(26.92,91.69) v5(26.92,87.88) v5(26.92,84.07) v5(26.92,76.45) v5(26.92,72.64) v5(26.92,68.83) v5(26.92,65.02) v5(26.92,61.21) v5(26.92,57.4) v5(26.92,53.59) v5(26.92,45.97) v5(26.92,42.16) v5(26.92,38.35) v5(26.92,34.54) v5(26.92,30.73) v5(26.92,26.92) v5(26.92,23.11) v5(26.92,19.3) v5(26.92,11.68) v5(26.92,7.87) v5(26.92,4.06) v5(26.92,0.25) v5(26.94,66.44) v5(26.94,50.54) v5(26.94,49.53) v5(26.94,33.28) v5(26.94,32.26) v5(26.94,16.36) v5(27.12,67.44) v5(27.12,15.36) v5(27.3,66.39) v5(27.3,50.53) v5(27.3,49.51) v5(27.3,33.29) v5(27.3,32.27) v5(27.3,16.42) v5(27.47,67.39) v5(27.47,15.41) v5(27.65,66.33) v5(27.65,50.5) v5(27.65,49.48) v5(27.65,33.32) v5(27.65,32.3) v5(27.65,16.47) v5(27.82,67.33) v5(27.82,15.47) v5(28,66.27) v5(28.01,50.46) v5(28.01,49.44) v5(28.01,33.37) v5(28.01,32.34) v5(28,16.53) v5(28.17,67.27) v5(28.17,15.53) v5(28.35,66.21) v5(28.36,50.41) v5(28.36,49.38) v5(28.36,33.42) v5(28.36,32.39) v5(28.35,16.6) v5(28.52,67.21) v5(28.52,15.6) v5(28.7,66.14) v5(28.71,50.35) v5(28.7,49.31) v5(28.7,33.5) v5(28.71,32.46) v5(28.7,16.66) v5(28.83,89.79) v5(28.83,85.98) v5(28.83,74.55) v5(28.83,70.74) v5(28.83,63.12) v5(28.83,59.31) v5(28.83,55.5) v5(28.83,51.69) v5(28.83,47.88) v5(28.83,44.07) v5(28.83,40.26) v5(28.83,36.45) v5(28.83,28.83) v5(28.83,25.02) v5(28.83,21.21) v5(28.83,17.4) v5(28.83,13.59) v5(28.83,9.78) v5(28.83,5.97) v5(28.83,2.16) v5(28.87,67.14) v5(28.87,15.66) v5(29.04,66.07) v5(29.05,50.27) v5(29.05,49.22) v5(29.05,33.58) v5(29.05,32.54) v5(29.04,16.74) v5(29.22,67.07) v5(29.22,15.73) v5(29.39,65.99) v5(29.4,50.18) v5(29.39,49.12) v5(29.39,33.69) v5(29.4,32.63) v5(29.39,16.81) v5(29.57,67) v5(29.57,15.81) v5(29.73,49) v5(29.73,33.8) v5(29.74,65.92) v5(29.74,50.07) v5(29.74,32.73) v5(29.74,16.89) v5(29.91,66.92) v5(29.91,15.89) v5(30.08,65.83) v5(30.07,49.96) v5(30.06,48.87) v5(30.06,33.93) v5(30.07,32.85) v5(30.08,16.97) v5(30.26,66.84) v5(30.26,15.97) v5(30.43,65.75) v5(30.41,49.83) v5(30.38,48.73) v5(30.38,34.07) v5(30.41,32.97) v5(30.43,17.06) v5(30.6,66.75) v5(30.6,16.05) v5(30.73,99.31) v5(30.73,91.69) v5(30.73,87.88) v5(30.73,76.45) v5(30.73,72.64) v5(30.73,68.83) v5(30.73,65.02) v5(30.73,61.21) v5(30.73,57.4) v5(30.73,53.59) v5(30.73,49.69) v5(30.7,48.58) v5(30.73,45.97) v5(30.73,42.16) v5(30.73,38.35) v5(30.7,34.23) v5(30.73,33.11) v5(30.73,30.73) v5(30.73,26.92) v5(30.73,23.11) v5(30.73,19.3) v5(30.73,15.49) v5(30.73,11.68) v5(30.73,7.87) v5(30.73,4.06) v5(30.73,0.25) v5(30.77,65.66) v5(30.77,17.15) v5(30.95,66.66) v5(31.02,48.41) v5(31.02,34.4) v5(30.95,16.14) v5(31.12,65.57) v5(31.05,49.54) v5(31.05,33.27) v5(31.12,17.24) v5(31.29,66.57) v5(31.32,48.23) v5(31.32,34.58) v5(31.29,16.23) v5(31.37,49.37) v5(31.37,33.43) v5(31.46,65.47) v5(31.46,17.33) v5(31.63,66.48) v5(31.62,48.03) v5(31.62,34.77) v5(31.63,16.33) v5(31.68,49.2) v5(31.68,33.6) v5(31.8,65.37) v5(31.8,17.43) v5(31.91,47.83) v5(31.91,34.98) v5(31.98,66.38) v5(31.98,49.01) v5(31.98,33.79) v5(31.98,16.43) v5(32.14,65.27) v5(32.19,47.61) v5(32.19,35.19) v5(32.14,17.54) v5(32.32,66.28) v5(32.28,48.82) v5(32.28,33.99) v5(32.32,16.53) v5(32.48,65.16) v5(32.47,47.38) v5(32.47,35.42) v5(32.48,17.64) v5(32.57,48.61) v5(32.57,34.2) v5(32.64,85.98) v5(32.64,82.17) v5(32.64,78.36) v5(32.64,74.55) v5(32.64,70.74) v5(32.64,66.93) v5(32.66,66.17) v5(32.64,63.12) v5(32.64,59.31) v5(32.64,55.5) v5(32.64,51.69) v5(32.73,47.14) v5(32.64,44.07) v5(32.64,36.45) v5(32.73,35.66) v5(32.64,32.64) v5(32.64,28.83) v5(32.64,25.02) v5(32.64,21.21) v5(32.66,16.63) v5(32.64,13.59) v5(32.64,9.78) v5(32.64,5.97) v5(32.64,2.16) v5(32.82,65.05) v5(32.82,17.75) v5(32.85,48.39) v5(32.85,34.41) v5(32.99,66.06) v5(32.98,46.89) v5(32.98,35.91) v5(32.99,16.74) v5(33.12,48.16) v5(33.12,34.64) v5(33.16,64.94) v5(33.16,17.87) v5(33.33,65.95) v5(33.24,46.65) v5(33.24,36.15) v5(33.33,16.85) v5(33.38,47.92) v5(33.38,34.88) v5(33.49,64.82) v5(33.5,46.41) v5(33.5,36.39) v5(33.49,17.99) v5(33.67,65.83) v5(33.64,47.67) v5(33.64,35.13) v5(33.67,16.97) v5(33.83,64.7) v5(33.78,46.18) v5(33.78,36.62) v5(33.83,18.11) v5(33.9,47.43) v5(33.9,35.38) v5(34,65.71) v5(34,17.09) v5(34.05,45.96) v5(34.05,36.84) v5(34.16,64.57) v5(34.16,47.19) v5(34.16,35.61) v5(34.16,18.23) v5(34.34,65.59) v5(34.43,46.96) v5(34.34,45.75) v5(34.34,37.06) v5(34.43,35.84) v5(34.34,17.21) v5(34.49,64.45) v5(34.49,18.36) v5(34.54,99.31) v5(34.54,76.45) v5(34.54,72.64) v5(34.54,68.83) v5(34.54,61.21) v5(34.54,57.4) v5(34.54,53.59) v5(34.54,49.78) v5(34.63,45.54) v5(34.54,38.35) v5(34.63,37.26) v5(34.54,34.54) v5(34.54,30.73) v5(34.54,26.92) v5(34.54,23.11) v5(34.54,19.3) v5(34.54,15.49) v5(34.54,11.68) v5(34.54,7.87) v5(34.54,4.06) v5(34.54,0.25) v5(34.67,65.47) v5(34.71,46.74) v5(34.71,36.07) v5(34.67,17.34) v5(34.82,64.32) v5(34.82,18.49) v5(34.92,45.35) v5(34.92,37.46) v5(35,65.34) v5(34.99,46.53) v5(34.99,36.28) v5(35,17.47) v5(35.15,64.18) v5(35.23,45.16) v5(35.23,37.65) v5(35.15,18.62) v5(35.33,65.21) v5(35.29,46.32) v5(35.29,36.48) v5(35.33,17.6) v5(35.48,64.04) v5(35.53,44.98) v5(35.53,37.83) v5(35.48,18.76) v5(35.58,46.13) v5(35.58,36.67) v5(35.66,65.07) v5(35.66,17.73) v5(35.81,63.9) v5(35.81,18.9) v5(35.89,45.95) v5(35.85,44.81) v5(35.85,38) v5(35.89,36.86) v5(35.99,64.93) v5(35.99,17.87) v5(36.13,63.76) v5(36.13,19.05) v5(36.2,45.77) v5(36.16,44.65) v5(36.16,38.16) v5(36.2,37.03) v5(36.31,64.79) v5(36.31,18.02) v5(36.45,89.79) v5(36.45,85.98) v5(36.45,74.55) v5(36.45,70.74) v5(36.45,66.93) v5(36.45,63.61) v5(36.45,63.12) v5(36.45,59.31) v5(36.45,55.5) v5(36.45,51.69) v5(36.45,47.88) v5(36.51,45.61) v5(36.48,44.49) v5(36.45,40.26) v5(36.48,38.31) v5(36.51,37.2) v5(36.45,36.45) v5(36.45,32.64) v5(36.45,28.83) v5(36.45,25.02) v5(36.45,21.21) v5(36.45,19.19) v5(36.45,17.4) v5(36.45,13.59) v5(36.45,9.78) v5(36.64,64.64) v5(36.64,18.16) v5(36.78,63.46) v5(36.83,45.45) v5(36.81,44.35) v5(36.81,38.45) v5(36.83,37.35) v5(36.78,19.35) v5(36.96,64.49) v5(36.96,18.31) v5(37.1,63.3) v5(37.1,19.5) v5(37.16,45.31) v5(37.14,44.22) v5(37.14,38.59) v5(37.16,37.5) v5(37.28,64.34) v5(37.28,18.46) v5(37.41,63.15) v5(37.41,19.66) v5(37.49,45.17) v5(37.47,44.1) v5(37.47,38.71) v5(37.49,37.63) v5(37.6,64.19) v5(37.6,18.62) v5(37.73,62.99) v5(37.73,19.82) v5(37.82,45.05) v5(37.81,43.98) v5(37.81,38.82) v5(37.82,37.75) v5(37.92,64.03) v5(37.92,18.77) v5(38.05,62.82) v5(38.05,19.98) v5(38.16,44.94) v5(38.15,43.88) v5(38.15,38.93) v5(38.16,37.87) v5(38.24,63.87) v5(38.24,18.94) v5(38.35,99.31) v5(38.35,91.69) v5(38.35,87.88) v5(38.35,84.07) v5(38.35,80.26) v5(38.35,76.45) v5(38.35,72.64) v5(38.35,68.83) v5(38.35,65.02) v5(38.36,62.65) v5(38.35,61.21) v5(38.35,49.78) v5(38.35,45.97) v5(38.35,34.54) v5(38.35,30.73) v5(38.35,26.92) v5(38.35,23.11) v5(38.36,20.15) v5(38.35,15.49) v5(38.35,11.68) v5(38.5,44.84) v5(38.49,43.78) v5(38.49,39.02) v5(38.5,37.97) v5(38.55,63.7) v5(38.55,19.1) v5(38.67,62.48) v5(38.67,20.32) v5(38.87,63.54) v5(38.84,44.74) v5(38.84,43.7) v5(38.84,39.1) v5(38.84,38.06) v5(38.87,19.27) v5(38.98,62.31) v5(38.98,20.5) v5(39.18,63.36) v5(39.19,44.66) v5(39.19,43.63) v5(39.19,39.18) v5(39.19,38.14) v5(39.18,19.44) v5(39.29,62.13) v5(39.29,20.67) v5(39.49,63.19) v5(39.49,19.61) v5(39.6,61.95) v5(39.54,44.59) v5(39.54,43.56) v5(39.54,39.24) v5(39.54,38.21) v5(39.6,20.85) v5(39.8,63.01) v5(39.8,19.79) v5(39.9,61.77) v5(39.89,44.54) v5(39.89,43.51) v5(39.89,39.3) v5(39.89,38.27) v5(39.9,21.04) v5(40.1,62.83) v5(40.1,19.97) v5(40.2,61.58) v5(40.2,21.22) v5(40.26,89.79) v5(40.26,85.98) v5(40.26,74.55) v5(40.26,70.74) v5(40.26,66.93) v5(40.26,59.31) v5(40.28,57.4) v5(40.26,47.88) v5(40.24,44.49) v5(40.24,43.47) v5(40.26,40.26) v5(40.24,39.34) v5(40.24,38.32) v5(40.26,36.45) v5(40.26,28.83) v5(40.26,25.02) v5(40.26,17.4) v5(40.26,13.59) v5(40.26,9.78) v5(40.41,62.65) v5(40.41,20.15) v5(40.5,61.39) v5(40.5,21.41) v5(40.6,44.45) v5(40.6,43.43) v5(40.6,39.37) v5(40.6,38.35) v5(40.71,62.46) v5(40.71,20.34) v5(40.8,61.2) v5(40.8,21.61) v5(41.01,62.27) v5(40.95,44.43) v5(40.95,43.41) v5(40.95,39.39) v5(40.95,38.38) v5(41.01,20.53) v5(41.1,61) v5(41.1,21.8) v5(41.31,62.08) v5(41.31,44.41) v5(41.31,43.4) v5(41.31,39.41) v5(41.31,38.39) v5(41.31,20.72) v5(41.4,60.8) v5(41.4,22) v5(41.61,61.89) v5(41.61,20.92) v5(41.69,60.6) v5(41.66,44.41) v5(41.66,43.39) v5(41.66,39.41) v5(41.66,38.39) v5(41.69,22.2) v5(41.9,61.69) v5(41.9,21.12) v5(41.98,60.4) v5(42.02,44.41) v5(42.02,43.39) v5(42.02,39.41) v5(42.02,38.39) v5(41.98,22.41) v5(42.16,99.31) v5(42.16,95.5) v5(42.16,91.69) v5(42.16,87.88) v5(42.16,76.45) v5(42.16,72.64) v5(42.16,68.83) v5(42.16,65.02) v5(42.2,61.49) v5(42.16,45.97) v5(42.16,34.54) v5(42.16,26.92) v5(42.16,23.11) v5(42.2,21.32) v5(42.16,19.3) v5(42.16,15.49) v5(42.16,11.68) v5(42.27,60.19) v5(42.27,22.62) v5(42.32,9.01) v5(42.32,8.65) v5(42.31,8.31) v5(42.31,7.95) v5(42.37,44.41) v5(42.37,43.39) v5(42.37,39.41) v5(42.37,38.39) v5(42.43,10.07) v5(42.38,9.72) v5(42.34,9.36) v5(42.47,84.1) v5(42.52,80.29) v5(42.49,61.28) v5(42.49,21.52) v5(42.5,10.42) v5(42.55,59.98) v5(42.55,22.83) v5(42.58,10.76) v5(42.73,44.41) v5(42.73,43.39) v5(42.73,39.41) v5(42.73,38.39) v5(42.68,11.11) v5(42.78,61.07) v5(42.78,21.73) v5(42.79,11.44) v5(42.84,59.76) v5(42.84,23.04) v5(42.92,11.77) v5(43.06,60.86) v5(43.12,59.55) v5(43.08,44.41) v5(43.08,43.39) v5(43.08,39.41) v5(43.08,38.39) v5(43.12,23.26) v5(43.06,21.94) v5(43.06,12.1) v5(43.21,12.42) v5(43.33,8.65) v5(43.33,8.31) v5(43.32,7.95) v5(43.35,60.65) v5(43.4,59.33) v5(43.4,23.48) v5(43.35,22.15) v5(43.38,12.73) v5(43.4,9.72) v5(43.36,9.36) v5(43.34,9.01) v5(43.44,45.15) v5(43.44,44.79) v5(43.44,44.41) v5(43.44,43.39) v5(43.44,39.41) v5(43.44,38.39) v5(43.44,38.04) v5(43.44,37.68) v5(43.46,10.07) v5(43.63,60.44) v5(43.63,22.37) v5(43.57,13.04) v5(43.63,10.76) v5(43.54,10.41) v5(43.68,59.1) v5(43.68,23.7) v5(43.79,45.51) v5(43.79,45.15) v5(43.79,44.79) v5(43.79,44.41) v5(43.79,43.39) v5(43.79,39.41) v5(43.79,38.39) v5(43.79,38.04) v5(43.79,37.68) v5(43.79,37.33) v5(43.76,13.34) v5(43.74,11.09) v5(43.91,60.22) v5(43.91,22.59) v5(43.87,11.43) v5(43.95,58.88) v5(43.95,23.93) v5(43.97,13.62) v5(44.02,11.75) v5(44.07,97.41) v5(44.07,93.6) v5(44.07,89.79) v5(44.07,85.98) v5(44.07,66.93) v5(44.07,63.12) v5(44.07,40.26) v5(44.07,28.83) v5(44.07,25.02) v5(44.07,21.21) v5(44.07,17.4) v5(44.07,9.78) v5(44.19,60) v5(44.22,58.65) v5(44.15,45.86) v5(44.15,45.51) v5(44.15,45.15) v5(44.15,44.79) v5(44.15,44.41) v5(44.15,43.39) v5(44.15,39.41) v5(44.15,38.39) v5(44.15,38.04) v5(44.15,37.68) v5(44.15,37.33) v5(44.15,36.97) v5(44.22,24.15) v5(44.19,22.81) v5(44.19,13.9) v5(44.18,12.07) v5(44.43,14.17) v5(44.35,12.38) v5(44.46,59.77) v5(44.49,58.42) v5(44.52,46.22) v5(44.51,45.86) v5(44.51,45.51) v5(44.51,45.15) v5(44.51,44.79) v5(44.51,44.41) v5(44.51,43.39) v5(44.51,39.41) v5(44.51,38.39) v5(44.51,38.04) v5(44.51,37.68) v5(44.51,37.33) v5(44.51,36.97) v5(44.51,36.62) v5(44.49,24.39) v5(44.46,23.03) v5(44.54,12.68) v5(44.68,55.47) v5(44.67,14.43) v5(44.74,59.54) v5(44.76,58.18) v5(44.76,24.62) v5(44.74,23.26) v5(44.75,12.97) v5(44.87,46.58) v5(44.87,46.22) v5(44.86,45.86) v5(44.86,45.51) v5(44.86,45.15) v5(44.86,44.79) v5(44.86,44.41) v5(44.86,43.39) v5(44.86,39.41) v5(44.86,38.39) v5(44.86,38.04) v5(44.86,37.68) v5(44.86,37.33) v5(44.86,36.97) v5(44.86,36.62) v5(44.86,36.26) v5(44.92,14.68) v5(45.01,59.31) v5(45.03,57.95) v5(45.03,24.86) v5(45.01,23.49) v5(44.97,13.25) v5(45.23,46.93) v5(45.23,46.58) v5(45.23,46.22) v5(45.22,45.86) v5(45.22,45.51) v5(45.22,45.15) v5(45.22,44.79) v5(45.22,44.41) v5(45.22,43.39) v5(45.22,39.41) v5(45.22,38.39) v5(45.22,38.04) v5(45.22,37.68) v5(45.22,37.33) v5(45.22,36.97) v5(45.22,36.62) v5(45.22,36.26) v5(45.22,35.9) v5(45.17,14.93) v5(45.2,13.51) v5(45.28,59.08) v5(45.29,57.71) v5(45.29,25.1) v5(45.28,23.72) v5(45.43,15.18) v5(45.45,13.77) v5(45.55,58.85) v5(45.55,57.47) v5(45.58,47.29) v5(45.58,46.93) v5(45.58,46.58) v5(45.58,46.22) v5(45.57,45.86) v5(45.57,45.51) v5(45.57,45.15) v5(45.57,44.79) v5(45.57,44.41) v5(45.57,43.39) v5(45.57,39.41) v5(45.57,38.39) v5(45.57,38.04) v5(45.57,37.68) v5(45.57,37.33) v5(45.57,36.97) v5(45.57,36.62) v5(45.57,36.26) v5(45.57,35.9) v5(45.57,35.55) v5(45.55,25.34) v5(45.55,23.96) v5(45.68,15.43) v5(45.7,14.02) v5(45.81,58.61) v5(45.81,57.22) v5(45.81,25.58) v5(45.81,24.19) v5(45.93,45.86) v5(45.93,45.51) v5(45.93,45.15) v5(45.93,44.79) v5(45.93,44.41) v5(45.93,43.39) v5(45.93,39.41) v5(45.93,38.39) v5(45.93,38.04) v5(45.93,37.68) v5(45.93,37.33) v5(45.93,36.97) v5(45.93,36.62) v5(45.93,36.26) v5(45.93,35.9) v5(45.93,35.55) v5(45.93,35.19) v5(45.93,15.68) v5(45.97,99.31) v5(45.97,95.5) v5(45.97,91.69) v5(45.97,87.88) v5(45.97,76.45) v5(45.97,53.59) v5(45.94,47.65) v5(45.94,47.29) v5(45.94,46.93) v5(45.94,46.58) v5(45.94,46.22) v5(45.97,30.73) v5(45.97,26.92) v5(45.97,23.11) v5(45.97,19.3) v5(45.95,14.27) v5(45.97,11.68) v5(46.07,58.37) v5(46.06,56.97) v5(46.06,25.83) v5(46.07,24.44) v5(46.18,15.94) v5(46.21,14.52) v5(46.33,58.13) v5(46.32,56.72) v5(46.29,48) v5(46.29,47.65) v5(46.29,47.29) v5(46.29,46.93) v5(46.29,46.58) v5(46.29,46.22) v5(46.28,44.41) v5(46.28,43.39) v5(46.28,39.41) v5(46.28,38.39) v5(46.28,36.62) v5(46.28,36.26) v5(46.28,35.9) v5(46.28,35.55) v5(46.28,35.19) v5(46.28,34.84) v5(46.32,26.08) v5(46.33,24.68) v5(46.43,16.19) v5(46.46,14.78) v5(46.59,57.88) v5(46.56,56.47) v5(46.56,26.33) v5(46.59,24.92) v5(46.63,84.07) v5(46.63,80.11) v5(46.65,48.36) v5(46.65,48) v5(46.65,47.65) v5(46.65,47.29) v5(46.65,46.93) v5(46.65,46.58) v5(46.65,46.22) v5(46.64,44.41) v5(46.64,43.39) v5(46.64,39.41) v5(46.64,38.39) v5(46.64,36.62) v5(46.64,36.26) v5(46.64,35.9) v5(46.64,35.55) v5(46.64,35.19) v5(46.64,34.84) v5(46.64,34.48) v5(46.68,16.44) v5(46.71,15.03) v5(46.81,56.21) v5(46.81,26.6) v5(46.84,57.63) v5(46.84,25.17) v5(46.93,16.69) v5(47,48.71) v5(47,48.36) v5(47,48) v5(47,47.65) v5(47,47.29) v5(47,46.93) v5(47,46.58) v5(47,46.22) v5(47,43.39) v5(47,39.41) v5(47,36.62) v5(47,36.26) v5(47,35.9) v5(47,35.55) v5(47,35.19) v5(47,34.84) v5(47,34.48) v5(47,34.13) v5(46.96,15.28) v5(47.1,57.38) v5(47.04,55.94) v5(47.04,26.86) v5(47.1,25.42) v5(47.19,16.94) v5(47.21,15.53) v5(47.26,55.66) v5(47.26,27.14) v5(47.34,57.13) v5(47.36,49.07) v5(47.36,48.71) v5(47.36,48.36) v5(47.36,48) v5(47.36,47.65) v5(47.36,47.29) v5(47.36,46.93) v5(47.36,46.58) v5(47.36,46.22) v5(47.35,44.41) v5(47.35,43.39) v5(47.35,39.41) v5(47.35,38.39) v5(47.35,36.62) v5(47.35,36.26) v5(47.35,35.9) v5(47.35,35.55) v5(47.35,35.19) v5(47.35,34.84) v5(47.35,34.48) v5(47.35,34.13) v5(47.35,33.77) v5(47.34,25.68) v5(47.48,55.38) v5(47.48,27.42) v5(47.44,17.19) v5(47.46,15.78) v5(47.58,56.86) v5(47.58,25.94) v5(47.69,55.1) v5(47.72,49.42) v5(47.72,49.07) v5(47.72,48.71) v5(47.72,48.36) v5(47.72,48) v5(47.72,47.65) v5(47.72,47.29) v5(47.72,46.93) v5(47.72,46.58) v5(47.72,46.22) v5(47.71,44.41) v5(47.71,43.39) v5(47.71,39.41) v5(47.71,38.39) v5(47.71,36.62) v5(47.71,36.26) v5(47.71,35.9) v5(47.71,35.55) v5(47.71,35.19) v5(47.71,34.84) v5(47.71,34.48) v5(47.71,34.13) v5(47.71,33.77) v5(47.71,33.42) v5(47.69,27.71) v5(47.69,17.44) v5(47.71,16.03) v5(47.82,56.59) v5(47.82,26.21) v5(47.88,89.79) v5(47.88,85.98) v5(47.88,82.17) v5(47.89,54.8) v5(47.88,51.69) v5(47.88,28.83) v5(47.89,28) v5(47.88,25.02) v5(47.88,21.21) v5(47.88,13.59) v5(47.88,9.78) v5(47.94,17.7) v5(47.97,16.28) v5(48.04,56.32) v5(48.08,54.5) v5(48.07,49.78) v5(48.07,49.42) v5(48.07,49.07) v5(48.07,48.71) v5(48.07,48.36) v5(48.07,48) v5(48.07,47.65) v5(48.07,47.29) v5(48.07,46.93) v5(48.07,46.58) v5(48.07,46.22) v5(48.06,44.41) v5(48.06,43.39) v5(48.06,39.41) v5(48.06,38.39) v5(48.06,36.62) v5(48.06,36.26) v5(48.06,35.9) v5(48.06,35.55) v5(48.06,35.19) v5(48.06,34.84) v5(48.06,34.48) v5(48.06,34.13) v5(48.06,33.77) v5(48.06,33.42) v5(48.06,33.06) v5(48.08,28.3) v5(48.04,26.48) v5(48.19,17.95) v5(48.22,16.54) v5(48.26,56.04) v5(48.27,54.2) v5(48.27,28.6) v5(48.26,26.77) v5(48.42,44.41) v5(48.42,43.39) v5(48.42,39.41) v5(48.42,38.39) v5(48.42,34.48) v5(48.42,34.13) v5(48.42,33.77) v5(48.42,33.42) v5(48.42,33.06) v5(48.42,32.7) v5(48.47,55.75) v5(48.44,53.89) v5(48.44,50.13) v5(48.44,49.77) v5(48.44,49.42) v5(48.44,49.06) v5(48.44,48.71) v5(48.44,48.35) v5(48.44,28.91) v5(48.47,27.05) v5(48.44,18.2) v5(48.47,16.79) v5(48.61,53.58) v5(48.61,29.23) v5(48.67,55.46) v5(48.67,27.34) v5(48.69,18.45) v5(48.72,17.04) v5(48.77,53.26) v5(48.8,50.48) v5(48.8,50.13) v5(48.8,49.77) v5(48.8,49.42) v5(48.8,49.06) v5(48.8,48.71) v5(48.8,48.35) v5(48.77,44.41) v5(48.77,43.39) v5(48.77,39.41) v5(48.77,38.39) v5(48.77,34.48) v5(48.77,34.13) v5(48.77,33.77) v5(48.77,33.42) v5(48.77,33.06) v5(48.77,32.7) v5(48.77,32.35) v5(48.77,29.55) v5(48.87,55.16) v5(48.92,52.93) v5(48.92,29.87) v5(48.87,27.64) v5(48.95,18.7) v5(48.97,17.29) v5(49.06,54.86) v5(49.05,52.61) v5(49.13,44.41) v5(49.13,43.39) v5(49.13,39.41) v5(49.13,38.39) v5(49.13,34.48) v5(49.13,34.13) v5(49.13,33.77) v5(49.13,33.42) v5(49.13,33.06) v5(49.13,32.7) v5(49.13,32.35) v5(49.13,31.99) v5(49.05,30.2) v5(49.06,27.94) v5(49.18,52.27) v5(49.15,50.84) v5(49.15,50.48) v5(49.15,50.13) v5(49.15,49.77) v5(49.15,49.42) v5(49.15,49.06) v5(49.15,48.71) v5(49.15,48.35) v5(49.18,30.53) v5(49.2,18.95) v5(49.22,17.54) v5(49.24,54.55) v5(49.3,51.94) v5(49.3,30.86) v5(49.24,28.25) v5(49.41,54.24) v5(49.41,51.6) v5(49.41,31.2) v5(49.41,28.56) v5(49.52,51.26) v5(49.51,49.42) v5(49.51,49.06) v5(49.51,48.71) v5(49.51,48.35) v5(49.48,34.48) v5(49.48,34.13) v5(49.48,33.77) v5(49.48,33.42) v5(49.52,31.54) v5(49.44,19.21) v5(49.47,17.79) v5(49.57,53.93) v5(49.61,50.92) v5(49.61,31.89) v5(49.57,28.88) v5(49.73,53.61) v5(49.69,50.57) v5(49.69,32.23) v5(49.73,29.2) v5(49.68,19.48) v5(49.73,18.04) v5(49.78,99.31) v5(49.78,95.5) v5(49.78,91.69) v5(49.78,87.88) v5(49.76,50.22) v5(49.82,49.87) v5(49.82,32.93) v5(49.76,32.58) v5(49.78,26.92) v5(49.78,23.11) v5(49.78,15.49) v5(49.78,11.68) v5(49.87,53.28) v5(49.87,49.52) v5(49.91,49.17) v5(49.91,33.64) v5(49.87,33.28) v5(49.87,29.52) v5(49.9,19.76) v5(50.01,52.95) v5(49.94,48.81) v5(49.96,48.46) v5(49.97,48.1) v5(49.98,47.75) v5(49.98,47.04) v5(49.98,46.68) v5(49.98,46.32) v5(49.98,45.97) v5(49.98,45.61) v5(49.98,45.26) v5(49.98,37.55) v5(49.98,37.19) v5(49.98,36.84) v5(49.98,36.48) v5(49.98,36.12) v5(49.98,35.77) v5(49.98,35.06) v5(49.97,34.7) v5(49.96,34.35) v5(49.94,33.99) v5(50.01,29.85) v5(49.98,18.3) v5(50.11,20.04) v5(50.14,52.62) v5(50.14,30.18) v5(50.22,18.56) v5(50.26,52.29) v5(50.26,30.52) v5(50.3,20.34) v5(50.37,51.95) v5(50.37,30.85) v5(50.47,51.61) v5(50.47,31.19) v5(50.48,20.65) v5(50.45,18.82) v5(50.57,51.27) v5(50.57,31.54) v5(50.65,50.92) v5(50.72,50.57) v5(50.72,32.23) v5(50.65,31.88) v5(50.65,20.96) v5(50.68,19.1) v5(50.79,50.22) v5(50.79,32.58) v5(50.8,21.28) v5(50.85,49.87) v5(50.89,49.52) v5(50.93,49.17) v5(50.93,33.64) v5(50.89,33.28) v5(50.85,32.93) v5(50.89,19.39) v5(50.98,84.18) v5(50.96,48.81) v5(50.98,48.46) v5(50.99,48.1) v5(50.99,47.75) v5(50.99,47.39) v5(50.99,47.04) v5(50.99,46.68) v5(50.99,46.32) v5(50.99,45.97) v5(50.99,45.61) v5(50.99,45.26) v5(50.99,37.55) v5(50.99,37.19) v5(50.99,36.84) v5(50.99,36.48) v5(50.99,36.12) v5(50.99,35.77) v5(50.99,35.41) v5(50.99,35.06) v5(50.99,34.7) v5(50.98,34.35) v5(50.96,33.99) v5(50.94,21.61) v5(51.06,21.95) v5(51.09,19.68) v5(51.17,22.28) v5(51.26,22.63) v5(51.27,19.98) v5(51.39,23.33) v5(51.34,22.98) v5(51.48,37.55) v5(51.48,37.19) v5(51.48,36.84) v5(51.48,36.48) v5(51.48,36.12) v5(51.48,35.77) v5(51.48,35.41) v5(51.48,35.06) v5(51.48,34.7) v5(51.48,34.35) v5(51.48,33.99) v5(51.48,33.63) v5(51.48,33.28) v5(51.48,32.92) v5(51.48,32.57) v5(51.48,32.21) v5(51.48,31.86) v5(51.48,31.5) v5(51.48,31.15) v5(51.48,30.79) v5(51.48,30.43) v5(51.48,30.08) v5(51.48,29.72) v5(51.48,29.37) v5(51.48,29.01) v5(51.48,28.66) v5(51.48,28.3) v5(51.48,27.95) v5(51.48,27.59) v5(51.48,27.23) v5(51.48,26.88) v5(51.48,26.52) v5(51.48,26.17) v5(51.48,25.81) v5(51.48,25.46) v5(51.48,25.1) v5(51.48,24.74) v5(51.48,24.39) v5(51.47,24.03) v5(51.44,23.68) v5(51.45,20.29) v5(51.61,20.61) v5(51.69,89.79) v5(51.69,85.98) v5(51.69,82.17) v5(51.69,70.74) v5(51.69,17.4) v5(51.69,13.59) v5(51.69,9.78) v5(51.69,5.97) v5(51.69,2.16) v5(51.76,20.93) v5(51.89,21.26) v5(51.99,49.34) v5(52.02,21.6) v5(52.12,21.94) v5(52.22,22.28) v5(52.3,22.62) v5(52.42,23.33) v5(52.37,22.97) v5(52.49,37.55) v5(52.49,37.19) v5(52.49,36.84) v5(52.49,36.48) v5(52.49,36.12) v5(52.49,35.77) v5(52.49,35.41) v5(52.49,35.06) v5(52.49,34.7) v5(52.49,34.35) v5(52.49,33.99) v5(52.49,33.63) v5(52.49,33.28) v5(52.49,32.92) v5(52.49,32.57) v5(52.49,32.21) v5(52.49,31.86) v5(52.49,31.5) v5(52.49,31.15) v5(52.49,30.79) v5(52.49,30.43) v5(52.49,30.08) v5(52.49,29.72) v5(52.49,29.37) v5(52.49,29.01) v5(52.49,28.66) v5(52.49,28.3) v5(52.49,27.95) v5(52.49,27.59) v5(52.49,27.23) v5(52.49,26.88) v5(52.49,26.52) v5(52.49,26.17) v5(52.49,25.81) v5(52.49,25.46) v5(52.49,25.1) v5(52.49,24.74) v5(52.49,24.39) v5(52.48,24.03) v5(52.46,23.68) v5(53.48,37.55) v5(53.48,37.19) v5(53.48,36.84) v5(53.48,36.48) v5(53.48,36.12) v5(53.48,35.77) v5(53.48,35.41) v5(53.48,35.06) v5(53.48,34.7) v5(53.48,34.35) v5(53.48,33.99) v5(53.48,33.63) v5(53.48,33.28) v5(53.48,32.92) v5(53.48,32.57) v5(53.48,32.21) v5(53.48,31.86) v5(53.48,31.5) v5(53.48,31.15) v5(53.48,30.79) v5(53.48,30.43) v5(53.48,30.08) v5(53.48,29.72) v5(53.48,29.37) v5(53.48,29.01) v5(53.48,28.66) v5(53.48,28.3) v5(53.48,27.95) v5(53.48,27.59) v5(53.48,27.23) v5(53.48,26.88) v5(53.48,26.52) v5(53.48,26.17) v5(53.48,25.81) v5(53.48,25.46) v5(53.48,25.1) v5(53.48,24.74) v5(53.48,24.39) v5(53.49,24.03) v5(53.51,23.68) v5(53.59,99.31) v5(53.59,95.5) v5(53.59,91.69) v5(53.59,87.88) v5(53.59,84.07) v5(53.59,61.21) v5(53.55,23.33) v5(53.6,22.97) v5(53.59,19.3) v5(53.59,15.49) v5(53.59,11.68) v5(53.59,7.87) v5(53.59,4.06) v5(53.59,0.25) v5(53.67,22.62) v5(53.75,22.28) v5(53.84,21.94) v5(53.95,21.6) v5(54.07,21.26) v5(54.21,20.93) v5(54.36,20.61) v5(54.49,37.55) v5(54.49,37.19) v5(54.49,36.84) v5(54.49,36.48) v5(54.49,36.12) v5(54.49,35.77) v5(54.49,35.41) v5(54.49,35.06) v5(54.49,34.7) v5(54.49,34.35) v5(54.49,33.99) v5(54.49,33.63) v5(54.49,33.28) v5(54.49,32.92) v5(54.49,32.57) v5(54.49,32.21) v5(54.49,31.86) v5(54.49,31.5) v5(54.49,31.15) v5(54.49,30.79) v5(54.49,30.43) v5(54.49,30.08) v5(54.49,29.72) v5(54.49,29.37) v5(54.49,29.01) v5(54.49,28.66) v5(54.49,28.3) v5(54.49,27.95) v5(54.49,27.59) v5(54.49,27.23) v5(54.49,26.88) v5(54.49,26.52) v5(54.49,26.17) v5(54.49,25.81) v5(54.49,25.46) v5(54.49,25.1) v5(54.49,24.74) v5(54.49,24.39) v5(54.5,24.03) v5(54.53,23.68) v5(54.52,20.29) v5(54.57,23.33) v5(54.63,22.98) v5(54.71,22.63) v5(54.7,19.98) v5(54.8,22.28) v5(54.91,21.95) v5(54.88,19.68) v5(55.01,48.81) v5(54.99,48.46) v5(54.98,48.1) v5(54.98,47.75) v5(54.98,47.39) v5(54.98,47.04) v5(54.98,46.68) v5(54.98,46.32) v5(54.98,45.97) v5(54.98,45.61) v5(54.98,45.26) v5(54.98,37.55) v5(54.98,37.19) v5(54.98,36.84) v5(54.98,36.48) v5(54.98,36.12) v5(54.98,35.77) v5(54.98,35.41) v5(54.98,35.06) v5(54.98,34.7) v5(54.99,34.35) v5(55.01,33.99) v5(55.03,21.61) v5(55.12,49.87) v5(55.07,49.52) v5(55.04,49.17) v5(55.04,33.64) v5(55.07,33.28) v5(55.12,32.93) v5(55.08,19.39) v5(55.18,50.22) v5(55.18,32.58) v5(55.17,21.28) v5(55.32,50.92) v5(55.24,50.57) v5(55.24,32.23) v5(55.32,31.88) v5(55.32,20.96) v5(55.29,19.1) v5(55.4,51.27) v5(55.4,31.54) v5(55.5,97.41) v5(55.5,85.98) v5(55.5,82.17) v5(55.5,70.74) v5(55.5,51.61) v5(55.5,31.19) v5(55.5,28.83) v5(55.5,25.02) v5(55.49,20.65) v5(55.51,18.82) v5(55.5,17.4) v5(55.5,13.59) v5(55.5,9.78) v5(55.63,89.76) v5(55.6,51.95) v5(55.6,30.85) v5(55.71,52.29) v5(55.71,30.52) v5(55.67,20.34) v5(55.83,52.62) v5(55.83,30.18) v5(55.75,18.56) v5(55.86,20.04) v5(55.96,52.95) v5(56.03,48.81) v5(56,48.46) v5(55.99,48.1) v5(55.99,47.75) v5(55.99,47.04) v5(55.99,46.68) v5(55.99,46.32) v5(55.99,45.97) v5(55.99,45.61) v5(55.99,45.26) v5(55.99,37.55) v5(55.99,37.19) v5(55.99,36.84) v5(55.99,36.48) v5(55.99,36.12) v5(55.99,35.77) v5(55.99,35.06) v5(55.99,34.7) v5(56,34.35) v5(56.03,33.99) v5(55.96,29.85) v5(55.99,18.3) v5(56.1,53.28) v5(56.1,49.52) v5(56.06,49.17) v5(56.06,33.64) v5(56.1,33.28) v5(56.1,29.52) v5(56.07,19.76) v5(56.21,50.22) v5(56.15,49.87) v5(56.15,32.93) v5(56.21,32.58) v5(56.24,53.61) v5(56.28,50.57) v5(56.28,32.23) v5(56.24,29.2) v5(56.29,19.48) v5(56.24,18.04) v5(56.4,53.93) v5(56.36,50.92) v5(56.36,31.89) v5(56.4,28.88) v5(56.45,51.26) v5(56.48,49.44) v5(56.48,49.08) v5(56.48,48.73) v5(56.48,48.37) v5(56.47,34.48) v5(56.47,34.13) v5(56.47,33.77) v5(56.47,33.42) v5(56.45,31.54) v5(56.53,19.21) v5(56.49,17.79) v5(56.56,54.24) v5(56.55,51.6) v5(56.55,31.2) v5(56.56,28.56) v5(56.73,54.55) v5(56.66,51.94) v5(56.66,30.86) v5(56.73,28.25) v5(56.78,52.27) v5(56.82,34.48) v5(56.82,34.13) v5(56.82,33.77) v5(56.82,33.42) v5(56.82,33.06) v5(56.82,32.7) v5(56.82,32.35) v5(56.82,31.99) v5(56.78,30.53) v5(56.77,18.95) v5(56.75,17.54) v5(56.91,54.86) v5(56.91,52.61) v5(56.84,50.86) v5(56.84,50.51) v5(56.84,50.15) v5(56.84,49.79) v5(56.84,49.44) v5(56.84,49.08) v5(56.84,48.73) v5(56.84,48.37) v5(56.84,44.41) v5(56.84,43.39) v5(56.84,39.41) v5(56.84,38.39) v5(56.91,30.2) v5(56.91,27.94) v5(57.02,18.7) v5(57,17.29) v5(57.1,55.16) v5(57.05,52.93) v5(57.05,29.87) v5(57.1,27.64) v5(57.2,53.26) v5(57.2,50.51) v5(57.2,50.15) v5(57.2,49.79) v5(57.2,49.44) v5(57.2,49.08) v5(57.2,48.73) v5(57.2,48.37) v5(57.2,44.41) v5(57.2,43.39) v5(57.2,39.41) v5(57.2,38.39) v5(57.18,34.48) v5(57.18,34.13) v5(57.18,33.77) v5(57.18,33.42) v5(57.18,33.06) v5(57.18,32.7) v5(57.18,32.35) v5(57.2,29.55) v5(57.3,55.46) v5(57.3,27.34) v5(57.27,18.45) v5(57.25,17.04) v5(57.4,84.07) v5(57.4,72.64) v5(57.4,65.02) v5(57.4,61.21) v5(57.36,53.58) v5(57.4,30.73) v5(57.36,29.23) v5(57.4,23.11) v5(57.4,19.3) v5(57.4,15.49) v5(57.4,11.68) v5(57.5,55.75) v5(57.53,53.89) v5(57.53,28.91) v5(57.5,27.05) v5(57.53,18.2) v5(57.5,16.79) v5(57.55,50.15) v5(57.55,49.79) v5(57.55,49.44) v5(57.55,49.08) v5(57.55,48.73) v5(57.55,48.37) v5(57.55,44.41) v5(57.55,43.39) v5(57.55,39.41) v5(57.55,38.39) v5(57.54,34.48) v5(57.54,34.13) v5(57.54,33.77) v5(57.54,33.42) v5(57.54,33.06) v5(57.54,32.7) v5(57.71,56.04) v5(57.7,54.2) v5(57.7,28.6) v5(57.71,26.77) v5(57.78,17.95) v5(57.75,16.54) v5(57.93,56.32) v5(57.88,54.5) v5(57.91,49.79) v5(57.91,49.44) v5(57.91,49.08) v5(57.91,48.73) v5(57.91,48.37) v5(57.91,48.02) v5(57.91,47.66) v5(57.91,47.31) v5(57.91,46.95) v5(57.91,46.59) v5(57.91,46.24) v5(57.91,44.41) v5(57.91,43.39) v5(57.91,39.41) v5(57.91,38.39) v5(57.9,36.61) v5(57.9,36.25) v5(57.9,35.9) v5(57.9,35.54) v5(57.9,35.18) v5(57.9,34.83) v5(57.9,34.47) v5(57.9,34.12) v5(57.9,33.76) v5(57.9,33.41) v5(57.9,33.05) v5(57.88,28.3) v5(57.93,26.48) v5(58.03,17.7) v5(58,16.28) v5(58.08,54.8) v5(58.08,28) v5(58.15,56.59) v5(58.15,26.21) v5(58.28,55.1) v5(58.26,49.44) v5(58.26,49.08) v5(58.26,48.73) v5(58.26,48.37) v5(58.26,48.02) v5(58.26,47.66) v5(58.26,47.31) v5(58.26,46.95) v5(58.26,46.59) v5(58.26,46.24) v5(58.26,44.41) v5(58.26,43.39) v5(58.26,39.41) v5(58.26,38.39) v5(58.25,36.61) v5(58.25,36.25) v5(58.25,35.9) v5(58.25,35.54) v5(58.25,35.18) v5(58.25,34.83) v5(58.25,34.47) v5(58.25,34.12) v5(58.25,33.76) v5(58.25,33.41) v5(58.28,27.71) v5(58.28,17.44) v5(58.25,16.03) v5(58.39,56.86) v5(58.39,25.94) v5(58.49,55.38) v5(58.49,27.42) v5(58.53,17.19) v5(58.51,15.78) v5(58.63,57.13) v5(58.62,49.08) v5(58.62,48.73) v5(58.62,48.37) v5(58.62,48.02) v5(58.62,47.66) v5(58.62,47.31) v5(58.62,46.95) v5(58.62,46.59) v5(58.62,46.24) v5(58.62,44.41) v5(58.62,43.39) v5(58.62,39.41) v5(58.62,38.39) v5(58.61,36.61) v5(58.61,36.25) v5(58.61,35.9) v5(58.61,35.54) v5(58.61,35.18) v5(58.61,34.83) v5(58.61,34.47) v5(58.61,34.12) v5(58.61,33.76) v5(58.63,25.68) v5(58.71,55.66) v5(58.71,27.14) v5(58.78,16.94) v5(58.76,15.53) v5(58.87,57.38) v5(58.93,55.94) v5(58.93,26.86) v5(58.87,25.42) v5(58.97,48.73) v5(58.97,48.37) v5(58.97,48.02) v5(58.97,47.66) v5(58.97,47.31) v5(58.97,46.95) v5(58.97,46.59) v5(58.97,46.24) v5(58.97,43.39) v5(58.97,39.41) v5(58.96,36.61) v5(58.96,36.25) v5(58.96,35.9) v5(58.96,35.54) v5(58.96,35.18) v5(58.96,34.83) v5(58.96,34.47) v5(58.96,34.12) v5(59.01,15.28) v5(59.12,57.63) v5(59.12,25.17) v5(59.03,16.69) v5(59.16,56.21) v5(59.16,26.6) v5(59.31,97.41) v5(59.31,89.79) v5(59.31,85.98) v5(59.31,82.17) v5(59.31,78.36) v5(59.31,74.55) v5(59.31,70.74) v5(59.31,55.5) v5(59.31,51.69) v5(59.33,48.37) v5(59.33,48.02) v5(59.33,47.66) v5(59.33,47.31) v5(59.33,46.95) v5(59.33,46.59) v5(59.33,46.24) v5(59.33,44.41) v5(59.33,43.39) v5(59.33,39.41) v5(59.33,38.39) v5(59.32,36.61) v5(59.32,36.25) v5(59.32,35.9) v5(59.32,35.54) v5(59.32,35.18) v5(59.32,34.83) v5(59.32,34.47) v5(59.31,28.83) v5(59.31,21.21) v5(59.31,17.4) v5(59.29,16.44) v5(59.26,15.03) v5(59.31,13.59) v5(59.31,9.78) v5(59.38,57.88) v5(59.4,56.47) v5(59.4,26.33) v5(59.38,24.92) v5(59.51,14.78) v5(59.54,16.19) v5(59.64,58.13) v5(59.65,56.72) v5(59.68,48.02) v5(59.68,47.66) v5(59.68,47.31) v5(59.68,46.95) v5(59.68,46.59) v5(59.68,46.24) v5(59.68,44.41) v5(59.68,43.39) v5(59.68,39.41) v5(59.68,38.39) v5(59.68,36.61) v5(59.68,36.25) v5(59.68,35.9) v5(59.68,35.54) v5(59.68,35.18) v5(59.68,34.83) v5(59.65,26.08) v5(59.64,24.68) v5(59.79,15.94) v5(59.76,14.52) v5(59.9,58.37) v5(59.91,56.97) v5(59.91,25.83) v5(59.9,24.44) v5(60.03,36.61) v5(60.03,36.25) v5(60.03,35.9) v5(60.03,35.54) v5(60.03,35.18) v5(60.01,14.27) v5(60.04,47.66) v5(60.04,47.31) v5(60.04,46.95) v5(60.04,46.59) v5(60.04,46.24) v5(60.04,45.88) v5(60.04,45.53) v5(60.04,45.17) v5(60.04,44.82) v5(60.04,44.41) v5(60.04,43.39) v5(60.04,39.41) v5(60.04,38.39) v5(60.04,38.03) v5(60.04,37.68) v5(60.04,37.32) v5(60.04,36.97) v5(60.04,15.68) v5(60.16,58.61) v5(60.16,57.22) v5(60.16,25.58) v5(60.16,24.19) v5(60.29,15.43) v5(60.27,14.02) v5(60.42,58.85) v5(60.42,57.47) v5(60.4,47.31) v5(60.4,46.95) v5(60.4,46.59) v5(60.4,46.24) v5(60.4,45.88) v5(60.4,45.53) v5(60.4,45.17) v5(60.4,44.82) v5(60.4,44.41) v5(60.4,43.39) v5(60.4,39.41) v5(60.4,38.39) v5(60.4,38.03) v5(60.4,37.68) v5(60.4,37.32) v5(60.4,36.97) v5(60.39,36.61) v5(60.39,36.25) v5(60.39,35.9) v5(60.39,35.54) v5(60.42,25.34) v5(60.42,23.96) v5(60.52,13.77) v5(60.54,15.18) v5(60.69,59.08) v5(60.68,57.71) v5(60.68,25.1) v5(60.69,23.72) v5(60.75,46.95) v5(60.75,46.59) v5(60.75,46.24) v5(60.75,45.88) v5(60.75,45.53) v5(60.75,45.17) v5(60.75,44.82) v5(60.75,44.41) v5(60.75,43.39) v5(60.75,39.41) v5(60.75,38.39) v5(60.75,38.03) v5(60.75,37.68) v5(60.75,37.32) v5(60.75,36.97) v5(60.74,36.61) v5(60.74,36.25) v5(60.74,35.9) v5(60.79,14.93) v5(60.76,13.51) v5(60.96,59.31) v5(60.94,57.95) v5(60.94,24.86) v5(60.96,23.49) v5(61,13.25) v5(61.11,46.59) v5(61.11,46.24) v5(61.11,45.88) v5(61.11,45.53) v5(61.11,45.17) v5(61.11,44.82) v5(61.11,44.41) v5(61.11,43.39) v5(61.11,39.41) v5(61.11,38.39) v5(61.11,38.03) v5(61.11,37.68) v5(61.11,37.32) v5(61.11,36.97) v5(61.1,36.61) v5(61.1,36.25) v5(61.05,14.68) v5(61.21,68.83) v5(61.21,65.02) v5(61.23,59.54) v5(61.21,58.18) v5(61.21,57.4) v5(61.21,53.59) v5(61.21,26.92) v5(61.21,24.62) v5(61.23,23.26) v5(61.21,19.3) v5(61.21,15.49) v5(61.22,12.97) v5(61.21,11.68) v5(61.3,14.43) v5(61.42,12.68) v5(61.52,87.91) v5(61.5,59.77) v5(61.48,58.42) v5(61.46,46.24) v5(61.46,45.88) v5(61.46,45.53) v5(61.46,45.17) v5(61.46,44.82) v5(61.46,44.41) v5(61.46,43.39) v5(61.46,39.41) v5(61.46,38.39) v5(61.46,38.03) v5(61.46,37.68) v5(61.46,37.32) v5(61.46,36.97) v5(61.45,36.61) v5(61.48,24.39) v5(61.5,23.03) v5(61.54,14.17) v5(61.62,12.38) v5(61.78,60) v5(61.75,58.65) v5(61.82,45.87) v5(61.82,45.53) v5(61.82,45.17) v5(61.82,44.82) v5(61.82,44.41) v5(61.82,43.39) v5(61.82,39.41) v5(61.82,38.39) v5(61.82,38.03) v5(61.82,37.68) v5(61.82,37.32) v5(61.82,36.97) v5(61.75,24.15) v5(61.78,22.81) v5(61.78,13.9) v5(61.79,12.07) v5(62.02,58.88) v5(62.02,23.93) v5(62,13.62) v5(61.95,11.75) v5(62.06,60.22) v5(62.06,22.59) v5(62.1,11.43) v5(62.17,45.53) v5(62.17,45.17) v5(62.17,44.82) v5(62.17,44.41) v5(62.17,43.39) v5(62.17,39.41) v5(62.17,38.39) v5(62.17,38.03) v5(62.17,37.68) v5(62.17,37.32) v5(62.21,13.34) v5(62.22,11.09) v5(62.29,59.1) v5(62.29,23.7) v5(62.34,60.44) v5(62.34,22.37) v5(62.4,13.04) v5(62.34,10.76) v5(62.43,10.41) v5(62.53,45.17) v5(62.53,44.82) v5(62.53,44.41) v5(62.53,43.39) v5(62.53,39.41) v5(62.53,38.39) v5(62.53,38.03) v5(62.53,37.68) v5(62.51,10.07) v5(62.62,60.65) v5(62.57,59.33) v5(62.57,23.48) v5(62.62,22.15) v5(62.59,12.73) v5(62.57,9.72) v5(62.61,9.36) v5(62.63,9.01) v5(62.63,7.95) v5(62.64,8.65) v5(62.64,8.3) v5(62.75,12.42) v5(62.91,60.86) v5(62.85,59.55) v5(62.89,44.41) v5(62.89,43.39) v5(62.89,39.41) v5(62.89,38.39) v5(62.85,23.26) v5(62.91,21.94) v5(62.91,12.1) v5(63.12,97.41) v5(63.13,59.76) v5(63.12,55.5) v5(63.12,47.88) v5(63.12,36.45) v5(63.12,25.02) v5(63.13,23.04) v5(63.12,21.21) v5(63.12,17.4) v5(63.12,13.59) v5(63.05,11.77) v5(63.19,61.07) v5(63.19,21.73) v5(63.18,11.44) v5(63.24,44.41) v5(63.24,43.39) v5(63.24,39.41) v5(63.24,38.39) v5(63.29,11.11) v5(63.42,59.98) v5(63.42,22.83) v5(63.39,10.76) v5(63.48,61.28) v5(63.48,21.52) v5(63.47,10.42) v5(63.6,44.41) v5(63.6,43.39) v5(63.6,39.41) v5(63.6,38.39) v5(63.54,10.07) v5(63.59,9.72) v5(63.63,9.36) v5(63.7,60.19) v5(63.7,22.62) v5(63.65,9.01) v5(63.65,8.65) v5(63.65,8.3) v5(63.65,7.95) v5(63.77,61.49) v5(63.77,21.32) v5(63.99,60.4) v5(63.95,44.41) v5(63.95,43.39) v5(63.95,39.41) v5(63.95,38.39) v5(63.99,22.41) v5(64.07,61.69) v5(64.07,21.12) v5(64.28,60.6) v5(64.31,44.41) v5(64.31,43.39) v5(64.31,39.41) v5(64.31,38.39) v5(64.28,22.2) v5(64.36,61.89) v5(64.36,20.92) v5(64.57,60.8) v5(64.57,22) v5(64.66,62.08) v5(64.66,44.41) v5(64.66,43.4) v5(64.66,39.41) v5(64.66,38.39) v5(64.66,20.72) v5(64.87,61) v5(64.87,21.8) v5(65.02,99.31) v5(65.02,95.5) v5(64.96,62.27) v5(65.02,57.4) v5(65.02,53.59) v5(65.02,49.78) v5(65.02,45.97) v5(65.02,44.43) v5(65.02,43.41) v5(65.02,39.39) v5(65.02,38.38) v5(65.02,34.54) v5(65.02,26.92) v5(65.02,23.11) v5(64.96,20.53) v5(65.02,19.3) v5(65.02,15.49) v5(65.02,11.68) v5(65.16,61.2) v5(65.16,21.61) v5(65.26,62.46) v5(65.26,20.34) v5(65.37,44.45) v5(65.37,43.43) v5(65.37,39.37) v5(65.37,38.35) v5(65.46,61.39) v5(65.46,21.41) v5(65.56,62.65) v5(65.56,20.15) v5(65.73,44.49) v5(65.73,43.47) v5(65.73,39.34) v5(65.73,38.32) v5(65.76,61.58) v5(65.76,21.22) v5(65.87,62.83) v5(65.87,19.97) v5(66.07,61.77) v5(66.08,44.54) v5(66.08,43.51) v5(66.08,39.3) v5(66.08,38.27) v5(66.07,21.04) v5(66.17,63.01) v5(66.17,19.79) v5(66.37,61.95) v5(66.43,44.59) v5(66.43,43.56) v5(66.43,39.24) v5(66.43,38.21) v5(66.37,20.85) v5(66.48,63.19) v5(66.48,19.61) v5(66.68,62.13) v5(66.68,20.67) v5(66.79,63.36) v5(66.78,44.66) v5(66.78,43.63) v5(66.78,39.18) v5(66.78,38.14) v5(66.79,19.44) v5(66.93,97.41) v5(66.93,59.31) v5(66.93,55.5) v5(66.93,51.69) v5(66.93,47.88) v5(66.93,40.26) v5(66.93,36.45) v5(66.93,32.64) v5(66.93,28.83) v5(66.93,25.02) v5(66.93,21.21) v5(66.93,17.4) v5(66.93,13.59) v5(66.93,9.78) v5(66.99,62.31) v5(66.99,20.5) v5(67.1,63.54) v5(67.13,44.74) v5(67.13,43.7) v5(67.13,39.1) v5(67.13,38.06) v5(67.1,19.27) v5(67.3,62.48) v5(67.3,20.32) v5(67.42,63.7) v5(67.42,19.1) v5(67.47,44.84) v5(67.48,43.78) v5(67.48,39.02) v5(67.47,37.97) v5(67.61,62.65) v5(67.61,20.15) v5(67.73,63.87) v5(67.73,18.94) v5(67.81,44.94) v5(67.82,43.88) v5(67.82,38.93) v5(67.81,37.87) v5(67.92,62.82) v5(67.92,19.98) v5(68.05,64.03) v5(68.05,18.77) v5(68.15,45.05) v5(68.16,43.98) v5(68.16,38.82) v5(68.15,37.75) v5(68.24,62.99) v5(68.24,19.82) v5(68.37,64.19) v5(68.37,18.62) v5(68.48,45.17) v5(68.5,44.1) v5(68.5,38.71) v5(68.48,37.63) v5(68.55,63.15) v5(68.55,19.66) v5(68.69,64.34) v5(68.69,18.46) v5(68.83,99.31) v5(68.83,95.5) v5(68.83,72.64) v5(68.83,65.02) v5(68.83,61.21) v5(68.83,57.4) v5(68.83,53.59) v5(68.83,49.78) v5(68.83,45.97) v5(68.81,45.31) v5(68.83,44.22) v5(68.83,38.59) v5(68.81,37.5) v5(68.83,34.54) v5(68.83,30.73) v5(68.83,26.92) v5(68.83,23.11) v5(68.83,15.49) v5(68.83,11.68) v5(68.87,63.3) v5(68.87,19.5) v5(69.01,64.49) v5(69.01,18.31) v5(69.19,63.46) v5(69.13,45.45) v5(69.16,44.35) v5(69.16,38.45) v5(69.13,37.35) v5(69.19,19.35) v5(69.33,64.64) v5(69.33,18.16) v5(69.52,63.61) v5(69.46,45.61) v5(69.48,44.49) v5(69.48,38.31) v5(69.46,37.2) v5(69.52,19.19) v5(69.66,64.79) v5(69.66,18.02) v5(69.77,45.77) v5(69.81,44.65) v5(69.81,38.16) v5(69.77,37.03) v5(69.84,63.76) v5(69.84,19.05) v5(69.98,64.93) v5(69.98,17.87) v5(70.08,45.95) v5(70.12,44.81) v5(70.12,38) v5(70.08,36.86) v5(70.16,63.9) v5(70.16,18.9) v5(70.31,65.07) v5(70.31,17.73) v5(70.38,46.13) v5(70.38,36.67) v5(70.49,64.04) v5(70.44,44.98) v5(70.44,37.83) v5(70.49,18.76) v5(70.64,65.21) v5(70.68,46.32) v5(70.68,36.48) v5(70.64,17.6) v5(70.74,97.41) v5(70.74,85.98) v5(70.74,66.93) v5(70.82,64.18) v5(70.74,63.12) v5(70.74,59.31) v5(70.74,55.5) v5(70.74,51.69) v5(70.74,47.88) v5(70.74,45.16) v5(70.74,44.07) v5(70.74,40.26) v5(70.74,37.65) v5(70.74,32.64) v5(70.74,28.83) v5(70.74,25.02) v5(70.74,21.21) v5(70.82,18.62) v5(70.74,13.59) v5(70.74,9.78) v5(70.97,65.34) v5(70.97,46.53) v5(70.97,36.28) v5(70.97,17.47) v5(71.04,45.35) v5(71.04,37.46) v5(71.15,64.32) v5(71.15,18.49) v5(71.3,65.47) v5(71.26,46.74) v5(71.26,36.07) v5(71.3,17.34) v5(71.34,45.54) v5(71.34,37.26) v5(71.48,64.45) v5(71.48,18.36) v5(71.63,65.59) v5(71.54,46.96) v5(71.63,45.75) v5(71.63,37.06) v5(71.54,35.84) v5(71.63,17.21) v5(71.81,64.57) v5(71.81,47.19) v5(71.81,35.61) v5(71.81,18.23) v5(71.92,45.96) v5(71.92,36.84) v5(71.97,65.71) v5(71.97,17.09) v5(72.07,47.43) v5(72.07,35.38) v5(72.14,64.7) v5(72.19,46.18) v5(72.19,36.62) v5(72.14,18.11) v5(72.29,73.3) v5(72.3,65.83) v5(72.33,47.67) v5(72.33,35.13) v5(72.3,16.97) v5(72.48,64.82) v5(72.46,46.41) v5(72.46,36.39) v5(72.48,17.99) v5(72.59,47.92) v5(72.59,34.88) v5(72.64,99.31) v5(72.64,95.5) v5(72.64,76.45) v5(72.64,68.83) v5(72.64,65.95) v5(72.64,61.21) v5(72.64,57.4) v5(72.64,53.59) v5(72.64,49.78) v5(72.73,46.65) v5(72.64,45.97) v5(72.64,42.16) v5(72.64,38.35) v5(72.73,36.15) v5(72.64,30.73) v5(72.64,26.92) v5(72.64,23.11) v5(72.64,19.3) v5(72.64,16.85) v5(72.64,15.49) v5(72.64,11.68) v5(72.64,7.87) v5(72.64,4.06) v5(72.64,0.25) v5(72.81,64.94) v5(72.81,17.87) v5(72.85,48.16) v5(72.85,34.64) v5(72.97,66.06) v5(72.99,46.89) v5(72.99,35.91) v5(72.97,16.74) v5(73.12,48.39) v5(73.12,34.41) v5(73.15,65.05) v5(73.15,17.75) v5(73.31,66.17) v5(73.24,47.14) v5(73.24,35.66) v5(73.31,16.63) v5(73.4,48.61) v5(73.4,34.2) v5(73.49,65.16) v5(73.5,47.38) v5(73.5,35.42) v5(73.49,17.64) v5(73.65,66.28) v5(73.69,48.82) v5(73.69,33.99) v5(73.65,16.53) v5(73.83,65.27) v5(73.78,47.61) v5(73.78,35.19) v5(73.83,17.54) v5(73.99,66.38) v5(73.99,49.01) v5(73.99,33.79) v5(73.99,16.43) v5(74.06,47.83) v5(74.06,34.98) v5(74.17,65.37) v5(74.17,17.43) v5(74.29,49.2) v5(74.29,33.6) v5(74.33,66.48) v5(74.35,48.03) v5(74.35,34.77) v5(74.33,16.33) v5(74.51,65.47) v5(74.51,17.33) v5(74.55,97.41) v5(74.55,85.98) v5(74.55,70.74) v5(74.55,63.12) v5(74.55,59.31) v5(74.55,55.5) v5(74.55,51.69) v5(74.6,49.37) v5(74.55,44.07) v5(74.55,40.26) v5(74.55,36.45) v5(74.6,33.43) v5(74.55,32.64) v5(74.55,28.83) v5(74.55,25.02) v5(74.55,21.21) v5(74.55,13.59) v5(74.55,9.78) v5(74.55,5.97) v5(74.55,2.16) v5(74.68,66.57) v5(74.65,48.23) v5(74.65,34.58) v5(74.68,16.23) v5(74.93,74.6) v5(74.85,65.57) v5(74.91,49.54) v5(74.91,33.27) v5(74.85,17.24) v5(75.02,66.66) v5(74.95,48.41) v5(74.95,34.4) v5(75.02,16.14) v5(75.19,65.66) v5(75.19,17.15) v5(75.24,49.69) v5(75.27,48.58) v5(75.27,34.23) v5(75.24,33.11) v5(75.37,66.75) v5(75.37,16.05) v5(75.54,65.75) v5(75.56,49.83) v5(75.59,48.73) v5(75.59,34.07) v5(75.56,32.97) v5(75.54,17.06) v5(75.71,66.84) v5(75.71,15.97) v5(75.88,65.83) v5(75.89,49.96) v5(75.91,48.87) v5(75.91,33.93) v5(75.89,32.85) v5(75.88,16.97) v5(76.06,66.92) v5(76.06,15.89) v5(76.23,65.92) v5(76.23,50.07) v5(76.23,32.73) v5(76.23,16.89) v5(76.24,49) v5(76.24,33.8) v5(76.4,67) v5(76.4,15.81) v5(76.45,99.31) v5(76.45,95.5) v5(76.45,87.88) v5(76.45,76.45) v5(76.45,72.64) v5(76.45,65.02) v5(76.45,61.21) v5(76.45,57.4) v5(76.45,45.97) v5(76.45,42.16) v5(76.45,38.35) v5(76.45,34.54) v5(76.45,30.73) v5(76.45,26.92) v5(76.45,23.11) v5(76.45,19.3) v5(76.45,11.68) v5(76.45,7.87) v5(76.45,4.06) v5(76.45,0.25) v5(76.58,65.99) v5(76.57,50.18) v5(76.58,49.12) v5(76.58,33.69) v5(76.57,32.63) v5(76.58,16.81) v5(76.75,67.07) v5(76.75,15.73) v5(76.92,66.07) v5(76.91,50.27) v5(76.92,49.22) v5(76.92,33.58) v5(76.91,32.54) v5(76.92,16.74) v5(77.1,67.14) v5(77.1,15.66) v5(77.27,66.14) v5(77.26,50.35) v5(77.26,49.31) v5(77.26,33.5) v5(77.26,32.46) v5(77.27,16.66) v5(77.45,67.21) v5(77.45,15.6) v5(77.62,66.21) v5(77.61,50.41) v5(77.61,49.38) v5(77.61,33.42) v5(77.61,32.39) v5(77.62,16.6) v5(77.8,67.27) v5(77.8,15.53) v5(77.97,66.27) v5(77.96,50.46) v5(77.96,49.44) v5(77.96,33.37) v5(77.96,32.34) v5(77.97,16.53) v5(78.15,67.33) v5(78.15,15.47) v5(78.32,66.33) v5(78.32,50.5) v5(78.32,49.48) v5(78.32,33.32) v5(78.32,32.3) v5(78.32,16.47) v5(78.36,97.41) v5(78.36,89.79) v5(78.36,85.98) v5(78.36,63.12) v5(78.36,59.31) v5(78.36,55.5) v5(78.36,51.69) v5(78.36,47.88) v5(78.36,44.07) v5(78.36,40.26) v5(78.36,36.45) v5(78.36,28.83) v5(78.36,25.02) v5(78.36,21.21) v5(78.36,17.4) v5(78.36,13.59) v5(78.36,9.78) v5(78.36,5.97) v5(78.36,2.16) v5(78.5,67.39) v5(78.5,15.41) v5(78.67,66.39) v5(78.67,50.53) v5(78.67,49.51) v5(78.67,33.29) v5(78.67,32.27) v5(78.67,16.42) v5(78.82,74.57) v5(78.85,67.44) v5(78.85,15.36) v5(79.02,66.44) v5(79.03,50.54) v5(79.03,49.53) v5(79.03,33.28) v5(79.03,32.26) v5(79.02,16.36) v5(79.07,70.79) v5(79.2,67.49) v5(79.2,15.31) v5(79.38,66.49) v5(79.38,50.55) v5(79.38,49.53) v5(79.38,33.27) v5(79.38,32.26) v5(79.38,16.31) v5(79.56,67.54) v5(79.56,15.26) v5(79.73,66.54) v5(79.73,16.27) v5(79.74,50.55) v5(79.74,49.53) v5(79.74,33.27) v5(79.74,32.26) v5(79.91,68.88) v5(79.91,67.58) v5(79.91,15.22) v5(80.08,66.58) v5(80.09,50.55) v5(80.09,49.53) v5(80.09,33.27) v5(80.09,32.26) v5(80.08,16.23) v5(80.26,99.31) v5(80.26,95.5) v5(80.26,91.69) v5(80.26,87.88) v5(80.26,76.45) v5(80.26,67.62) v5(80.26,65.02) v5(80.26,61.21) v5(80.26,57.4) v5(80.26,53.59) v5(80.26,45.97) v5(80.26,42.16) v5(80.26,38.35) v5(80.26,34.54) v5(80.26,30.73) v5(80.26,26.92) v5(80.26,23.11) v5(80.26,19.3) v5(80.26,15.18) v5(80.26,11.68) v5(80.26,7.87) v5(80.26,4.06) v5(80.26,0.25) v5(80.44,66.62) v5(80.45,50.55) v5(80.45,49.53) v5(80.45,33.27) v5(80.45,32.26) v5(80.44,16.19) v5(80.62,67.66) v5(80.62,15.15) v5(80.79,66.65) v5(80.8,50.55) v5(80.8,49.53) v5(80.8,33.27) v5(80.8,32.26) v5(80.79,16.15) v5(80.97,67.69) v5(80.97,15.12) v5(81.14,66.68) v5(81.16,50.55) v5(81.16,49.53) v5(81.16,33.27) v5(81.16,32.26) v5(81.14,16.12) v5(81.28,70.87) v5(81.33,67.72) v5(81.33,15.09) v5(81.41,72.67) v5(81.5,66.71) v5(81.52,50.55) v5(81.52,49.53) v5(81.52,33.27) v5(81.52,32.26) v5(81.5,16.09) v5(81.68,67.74) v5(81.68,15.06) v5(81.85,66.74) v5(81.87,50.55) v5(81.87,49.53) v5(81.87,33.27) v5(81.87,32.26) v5(81.85,16.07) v5(82.04,67.76) v5(82.04,15.04) v5(82.17,89.79) v5(82.17,85.98) v5(82.17,74.55) v5(82.21,66.76) v5(82.17,63.12) v5(82.17,59.31) v5(82.17,55.5) v5(82.17,51.69) v5(82.23,50.55) v5(82.23,49.53) v5(82.17,47.88) v5(82.17,44.07) v5(82.17,40.26) v5(82.17,36.45) v5(82.23,33.27) v5(82.23,32.26) v5(82.17,28.83) v5(82.17,25.02) v5(82.17,21.21) v5(82.17,17.4) v5(82.21,16.05) v5(82.17,13.59) v5(82.17,9.78) v5(82.17,5.97) v5(82.17,2.16) v5(82.39,67.78) v5(82.39,15.02) v5(82.56,66.77) v5(82.58,50.55) v5(82.58,49.53) v5(82.58,33.27) v5(82.58,32.26) v5(82.56,16.03) v5(82.75,67.8) v5(82.75,15.01) v5(82.92,66.79) v5(82.92,16.02) v5(82.94,50.55) v5(82.94,49.53) v5(82.94,33.27) v5(82.94,32.26) v5(83.1,67.81) v5(83.1,15) v5(83.27,66.79) v5(83.29,50.55) v5(83.29,49.53) v5(83.29,33.27) v5(83.29,32.26) v5(83.27,16.01) v5(83.46,67.81) v5(83.46,14.99) v5(83.63,66.8) v5(83.63,16) v5(83.67,68.86) v5(83.65,50.55) v5(83.65,49.53) v5(83.65,33.27) v5(83.65,32.26) v5(83.81,67.82) v5(83.81,14.99) v5(83.99,66.8) v5(84,50.55) v5(84,49.53) v5(84,33.27) v5(84,32.26) v5(83.99,16) v5(84.07,99.31) v5(84.07,95.5) v5(84.07,91.69) v5(84.07,87.88) v5(84.07,76.45) v5(84.07,72.64) v5(84.07,65.02) v5(84.07,61.21) v5(84.07,57.4) v5(84.07,53.59) v5(84.07,45.97) v5(84.07,42.16) v5(84.07,38.35) v5(84.07,34.54) v5(84.07,30.73) v5(84.07,26.92) v5(84.07,23.11) v5(84.07,19.3) v5(84.07,11.68) v5(84.07,7.87) v5(84.07,4.06) v5(84.07,0.25) v5(84.17,67.82) v5(84.17,14.99) v5(84.37,66.8) v5(84.36,50.55) v5(84.36,49.53) v5(84.36,33.27) v5(84.36,32.26) v5(84.34,16) v5(84.52,67.82) v5(84.52,14.99) v5(84.73,66.8) v5(84.72,50.55) v5(84.72,49.53) v5(84.72,33.27) v5(84.72,32.26) v5(84.7,16) v5(84.88,67.82) v5(84.88,14.99) v5(85.01,70.71) v5(85.08,66.8) v5(85.07,50.55) v5(85.07,49.53) v5(85.07,33.27) v5(85.07,32.26) v5(85.05,16) v5(85.23,67.82) v5(85.23,14.99) v5(85.43,50.55) v5(85.43,49.53) v5(85.43,33.27) v5(85.43,32.26) v5(85.41,16) v5(85.44,66.8) v5(85.59,67.82) v5(85.59,14.99) v5(85.79,66.8) v5(85.78,50.55) v5(85.78,49.53) v5(85.78,33.27) v5(85.78,32.26) v5(85.76,16) v5(85.98,89.79) v5(85.98,85.98) v5(85.98,78.36) v5(85.98,74.55) v5(85.95,67.82) v5(85.98,63.12) v5(85.98,59.31) v5(85.98,55.5) v5(85.98,51.69) v5(85.98,47.88) v5(85.98,44.07) v5(85.98,40.26) v5(85.98,36.45) v5(85.98,28.83) v5(85.98,25.02) v5(85.98,21.21) v5(85.98,17.4) v5(85.95,14.99) v5(85.98,13.59) v5(85.98,9.78) v5(85.98,5.97) v5(85.98,2.16) v5(86.15,66.8) v5(86.14,50.55) v5(86.14,49.53) v5(86.14,33.27) v5(86.14,32.26) v5(86.3,67.82) v5(86.5,66.8) v5(86.49,50.55) v5(86.49,49.53) v5(86.49,33.27) v5(86.49,32.26) v5(86.85,50.55) v5(86.85,49.53) v5(86.85,33.27) v5(86.85,32.26) v5(87.2,50.55) v5(87.2,49.53) v5(87.2,33.27) v5(87.2,32.26) v5(87.56,50.55) v5(87.56,49.53) v5(87.56,33.27) v5(87.56,32.26) v5(87.88,99.31) v5(87.88,95.5) v5(87.88,91.69) v5(87.88,87.88) v5(87.88,84.07) v5(87.88,80.26) v5(87.88,76.45) v5(87.88,57.4) v5(87.88,53.59) v5(87.92,50.55) v5(87.92,49.53) v5(87.88,45.97) v5(87.88,42.16) v5(87.88,38.35) v5(87.88,34.54) v5(87.92,33.27) v5(87.92,32.26) v5(87.88,30.73) v5(87.88,26.92) v5(87.88,23.11) v5(87.88,7.87) v5(87.88,0.25) v5(88.27,50.55) v5(88.27,49.53) v5(88.27,33.27) v5(88.27,32.26) v5(88.63,50.55) v5(88.63,49.53) v5(88.63,33.27) v5(88.63,32.26) v5(88.98,50.55) v5(88.98,49.53) v5(88.98,33.27) v5(88.98,32.26) v5(89.34,50.55) v5(89.34,49.53) v5(89.34,33.27) v5(89.34,32.26) v5(89.69,50.55) v5(89.69,49.53) v5(89.69,33.27) v5(89.69,32.26) v5(89.79,93.6) v5(89.79,89.79) v5(89.79,85.98) v5(89.79,82.17) v5(89.79,78.36) v5(89.79,74.55) v5(89.79,59.31) v5(89.79,55.5) v5(89.79,51.69) v5(89.79,47.88) v5(89.79,44.07) v5(89.79,40.26) v5(89.79,36.45) v5(89.79,28.83) v5(89.79,25.02) v5(90.05,50.55) v5(90.05,49.53) v5(90.05,33.27) v5(90.05,32.26) v5(90.41,50.55) v5(90.41,49.53) v5(90.41,33.27) v5(90.41,32.26) v5(90.76,50.55) v5(90.76,49.53) v5(90.76,33.27) v5(90.76,32.26) v5(91.12,50.55) v5(91.12,49.53) v5(91.12,33.27) v5(91.12,32.26) v5(91.47,50.55) v5(91.47,49.53) v5(91.47,33.27) v5(91.47,32.26) v5(91.69,99.31) v5(91.69,91.69) v5(91.69,87.88) v5(91.69,84.07) v5(91.69,80.26) v5(91.69,76.45) v5(91.69,57.4) v5(91.69,53.59) v5(91.69,45.97) v5(91.69,42.16) v5(91.69,38.35) v5(91.69,34.54) v5(91.69,30.73) v5(91.69,26.92) v5(91.69,7.87) v5(91.69,0.25) v5(91.83,50.55) v5(91.83,49.53) v5(91.83,33.27) v5(91.83,32.26) v5(92.18,50.55) v5(92.18,49.53) v5(92.18,33.27) v5(92.18,32.26) v5(92.54,50.55) v5(92.54,49.53) v5(92.54,33.27) v5(92.54,32.26) v5(92.89,50.55) v5(92.89,49.53) v5(92.89,33.27) v5(92.89,32.26) v5(93.25,50.55) v5(93.25,49.53) v5(93.25,33.27) v5(93.25,32.26) v5(93.6,97.41) v5(93.6,93.6) v5(93.6,89.79) v5(93.6,85.98) v5(93.6,82.17) v5(93.6,78.36) v5(93.6,74.55) v5(93.6,59.31) v5(93.6,55.5) v5(93.6,51.69) v5(93.61,50.55) v5(93.61,49.53) v5(93.6,47.88) v5(93.6,44.07) v5(93.6,40.26) v5(93.6,36.45) v5(93.61,33.27) v5(93.61,32.26) v5(93.6,28.83) v5(93.6,25.02) v5(93.6,5.97) v5(93.6,2.16) v5(93.96,50.55) v5(93.96,49.53) v5(93.96,33.27) v5(93.96,32.26) v5(94.32,50.55) v5(94.32,49.53) v5(94.32,33.27) v5(94.32,32.26) v5(94.67,50.55) v5(94.67,49.53) v5(94.67,33.27) v5(94.67,32.26) v5(95.03,50.55) v5(95.03,49.53) v5(95.03,33.27) v5(95.03,32.26) v5(95.38,50.55) v5(95.38,49.53) v5(95.38,33.27) v5(95.38,32.26) v5(95.5,53.59) v5(95.5,45.97) v5(95.5,42.16) v5(95.5,38.35) v5(95.5,34.54) v5(95.5,30.73) v5(95.5,26.92) v5(95.74,50.55) v5(95.74,49.53) v5(95.74,33.27) v5(95.74,32.26) v5(96.09,50.55) v5(96.09,49.53) v5(96.09,33.27) v5(96.09,32.26) v5(96.45,50.55) v5(96.45,49.53) v5(96.45,33.27) v5(96.45,32.26) v5(96.81,50.55) v5(96.81,49.53) v5(96.81,33.27) v5(96.81,32.26) v5(97.16,50.55) v5(97.16,49.53) v5(97.16,33.27) v5(97.16,32.26) v5(97.41,55.5) v5(97.41,51.69) v5(97.41,47.88) v5(97.41,44.07) v5(97.41,40.26) v5(97.41,36.45) v5(97.41,28.83) v5(97.52,50.54) v5(97.52,49.53) v5(97.51,33.27) v5(97.51,32.26) v5(97.88,50.54) v5(97.87,49.53) v5(97.87,33.27) v5(97.84,32.26) v5(99.31,42.16) v5(103.12,42.16) v6(49.48,44.9) v6(49.48,44.4) v6(49.48,43.4) v6(49.48,42.9) v6(49.48,42.4) v6(49.48,41.9) v6(49.48,40.9) v6(49.48,40.4) v6(49.48,39.9) v6(49.48,39.4) v6(49.48,38.4) v6(49.48,37.9) v6(49.73,44.4) v6(49.73,43.38) v6(49.73,39.4) v6(49.73,38.4) v6(49.98,44.9) v6(49.99,44.65) v6(49.98,44.4) v6(49.99,44.15) v6(49.98,43.9) v6(49.99,43.66) v6(49.98,43.4) v6(49.98,42.9) v6(49.98,42.4) v6(49.98,41.9) v6(49.98,41.4) v6(49.98,40.9) v6(49.98,40.4) v6(49.98,39.9) v6(49.99,39.14) v6(49.98,38.9) v6(49.99,38.66) v6(49.98,38.4) v6(49.99,38.15) v6(49.98,37.9) v6(50.24,44.4) v6(50.24,38.4) v6(50.42,42.9) v6(50.42,42.4) v6(50.42,41.9) v6(50.42,41.4) v6(50.42,40.9) v6(50.42,40.4) v6(50.42,39.9) v6(50.48,44.4) v6(50.48,43.9) v6(50.48,38.9) v6(50.48,38.4) v6(50.72,44.4) v6(50.72,38.4) v6(50.85,42.9) v6(50.85,42.4) v6(50.85,41.9) v6(50.85,41.4) v6(50.85,40.9) v6(50.85,40.4) v6(50.85,39.9) v6(50.98,44.9) v6(50.98,44.65) v6(50.98,44.4) v6(51,43.38) v6(51,39.45) v6(50.98,38.4) v6(50.98,38.15) v6(50.98,37.9) v6(51.48,44.9) v6(51.48,44.4) v6(51.48,43.86) v6(51.48,43.38) v6(51.48,42.9) v6(51.48,41.9) v6(51.48,40.9) v6(51.48,39.9) v6(51.48,39.43) v6(51.48,38.97) v6(51.48,38.4) v6(51.49,38.15) v6(51.48,37.9) v6(51.74,38.4) v6(51.98,44.4) v6(51.98,43.86) v6(51.98,43.38) v6(51.98,42.4) v6(51.98,41.9) v6(51.98,41.4) v6(51.98,40.9) v6(51.98,40.4) v6(51.98,39.9) v6(51.98,39.43) v6(51.98,38.97) v6(51.98,38.4) v6(52.25,38.4) v6(52.48,44.4) v6(52.48,43.86) v6(52.48,43.38) v6(52.48,42.4) v6(52.48,41.9) v6(52.48,41.4) v6(52.48,40.9) v6(52.48,40.4) v6(52.48,39.9) v6(52.48,39.43) v6(52.48,38.97) v6(52.48,38.4) v6(52.48,38.15) v6(52.48,37.9) v6(52.98,43.86) v6(52.98,43.38) v6(52.98,42.4) v6(52.98,41.9) v6(52.98,41.4) v6(52.98,40.9) v6(52.98,40.4) v6(52.98,39.43) v6(52.98,38.97) v6(52.98,38.4) v6(52.98,37.9) v6(53.48,44.4) v6(53.48,43.86) v6(53.48,43.38) v6(53.48,42.4) v6(53.48,41.9) v6(53.48,41.4) v6(53.48,40.9) v6(53.48,40.4) v6(53.48,39.9) v6(53.48,39.43) v6(53.48,38.97) v6(53.48,38.4) v6(53.49,38.15) v6(53.48,37.9) v6(53.75,38.4) v6(53.98,43.38) v6(53.98,42.4) v6(53.98,41.9) v6(53.98,41.4) v6(53.98,40.9) v6(53.98,40.4) v6(53.98,39.9) v6(53.98,39.43) v6(53.98,38.97) v6(53.98,38.4) v6(54.23,38.4) v6(54.48,44.9) v6(54.48,44.4) v6(54.48,42.9) v6(54.48,41.9) v6(54.48,40.9) v6(54.48,39.9) v6(54.48,39.43) v6(54.48,38.97) v6(54.48,38.4) v6(54.48,38.15) v6(54.48,37.9) v6(54.98,44.9) v6(54.99,44.65) v6(54.98,44.4) v6(54.98,38.4) v6(54.99,38.15) v6(54.98,37.9) v6(55.06,41.35) v6(55.06,40.85) v6(55.06,40.35) v6(55.06,39.85) v6(55.06,39.38) v6(55.25,44.4) v6(55.25,38.4) v6(55.48,44.4) v6(55.48,43.9) v6(55.49,40.86) v6(55.49,40.36) v6(55.49,39.89) v6(55.48,38.9) v6(55.48,38.4) v6(55.73,44.4) v6(55.73,38.4) v6(55.98,44.9) v6(55.98,44.65) v6(55.98,44.4) v6(55.98,44.15) v6(55.98,43.9) v6(55.98,43.66) v6(55.98,43.4) v6(55.98,42.9) v6(55.98,42.4) v6(55.98,40.9) v6(55.98,40.4) v6(55.98,39.9) v6(55.98,39.4) v6(55.98,39.14) v6(55.98,38.9) v6(55.98,38.66) v6(55.98,38.4) v6(55.98,38.15) v6(55.98,37.9) v6(56.24,44.4) v6(56.24,43.41) v6(56.24,39.4) v6(56.24,38.4) v6(56.48,44.9) v6(56.48,44.4) v6(56.48,43.4) v6(56.48,42.9) v6(56.48,42.4) v6(56.48,41.9) v6(56.48,40.9) v6(56.48,40.4) v6(56.48,39.9) v6(56.48,39.4) v6(56.48,38.4) v6(56.48,37.9)
